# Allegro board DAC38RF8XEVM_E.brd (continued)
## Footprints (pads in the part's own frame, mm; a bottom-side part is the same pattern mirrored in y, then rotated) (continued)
QFN_RLT_7
  rect 1.016x0.305 smd: 1(-1.06,0.75) 2(-1.06,0.25) 3(-1.06,-0.25) 4(-1.06,-0.75)
  rect 1.829x0.356 smd: 5(0.66,-0.6) 6(0.66,0) 7(0.66,0.6)
SMA_SMEL_DUAL_PSF-S01_250X215
  rect 0.508x4.064 smd: 1(0,-2.032)
  rect 3.048x4.064 smd: 2(-3.556,-2.032) 3(3.556,-2.032) 4(-3.556,-2.032) 5(3.556,-2.032)
SMA_THVT_312X312
  round 2.337 hole 1.575: 1(0,0)
  round 2.464 hole 1.702: 2(-2.54,2.54) 3(2.54,2.54) 4(2.54,-2.54) 5(-2.54,-2.54)
SMD_JUMPER_L_0402
  rect 0.508x0.508 smd: 1(-0.508,0) 2(0.508,0) 3(0.508,1.016)
SON_DRB_8
  rect 0.813x0.381 smd: 1(-1.453,0.975) 2(-1.453,0.325) 3(-1.453,-0.325) 4(-1.453,-0.975) 5(1.453,-0.975) 6(1.453,-0.325) 7(1.453,0.325) 8(1.453,0.975)
  rect 1.524x3 smd: 9(0,0)
SON_DSG_8
  rect 0.508x0.33 smd: 1(-0.903,0.75) 2(-0.903,0.25) 3(-0.903,-0.25) 4(-0.903,-0.75) 5(0.903,-0.75) 6(0.903,-0.25) 7(0.903,0.25) 8(0.903,0.75)
  rect 0.762x1.778 smd: 9(0,0)
SON_Q5B_8
  rect 1.372x0.711 smd: 1(-2.767,1.905) 2(-2.767,0.635) 3(-2.767,-0.635) 4(-2.767,-1.905) 5(2.767,-1.905) 6(2.767,-0.635) 7(2.767,0.635) 8(2.767,1.905)
SOT_416_3_63X31
  rect 0.508x0.356 smd: 1(0,-0.152) 2(0,-1.168) 3(1.295,-0.66)
SW_THVT_SPST_PTS635SL43
  round 2.159 hole 1.397: 1(-3.251,0) 2(3.251,0)
TESTPOINT_62DIA
  round 2.337 hole 1.575: 1(0,0)
TFMR_5_150X150_50
  rect 1.651x0.762 smd: 1(1.587,1.27) 2(1.587,0) 3(1.587,-1.27) 4(-1.587,-1.27) 6(-1.587,1.27)
TFMR_6_160X150_50
  rect 1.651x0.762 smd: 1(1.587,1.27) 2(1.587,0) 3(1.587,-1.27) 4(-1.587,-1.27) 5(-1.587,0) 6(-1.587,1.27)
TP_THVT_060_RND
  round 1.575 hole 1.016: 1(0,0)
unnamed#2
  round 2.286 hole 3.175 unplated: (0,0)
VCXO_6_CUSTOM
  rect 5.74x1.956 smd: 1(-3.81,2.54) 2(-3.81,0) 3(-3.81,-2.54) 4(3.81,-2.54) 5(3.81,0) 6(3.81,2.54)
XTAL_4_SM_130X102
  rect 1.4x1.2 smd: 1(-1.1,-0.85) 2(1.1,-0.85) 3(1.1,0.85) 4(-1.1,0.85)

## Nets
1.8V_USB: C74.1 C75.1 C82.2 C84.2 C86.2 C369.2 U4.12(VCORE#12) U4.37(VCORE#37) U4.49(VREGOUT) U4.64(VCORE#64) U29.2(VCCA) U29.10(OE)
1.8VCLK: C379.1 C380.1 C381.1 C382.1 C383.1 C419.1 JP10.1 PP26.1 R218.1 R219.1 U30.9(VCC#9) U30.12(VCC#12) U30.13(VCC#13) U30.14(VCC#14) U30.16(VCC#16)
3.3V_USB: C73.1 C80.2 C81.2 C83.2 C85.2 C87.2 C368.1 FB12.1 FB14.1 FB36.3 R71.2 R72.2 R73.2 U4.20(VCCIO#20) U4.31(VCCIO#31) U4.42(VCCIO#42) U4.50(VREGIN) U4.56(VCCIO#56) U5.6(ORG) U5.8(VCC) U29.19(VCCB)
5.0V_SOURCE: F1.1 J21.1 Q4.5(D5) Q4.6(D6) Q4.7(D7) Q4.8(D8) TP21.1(TP) U9.5(VIN)
5VUSB: R64.1 R67.1
+0.9V_VDDA: C139.1 C140.1 C141.1 C271.1 C272.1 C348.2 FB27.3 PP4.1 U1.F11(VDDA_09V#F11) U1.J11(VDDA_09V#J11)
+0.9V_VDDCLK: C135.1 C136.1 C137.1 C268.1 C269.1 C343.2 FB26.3 PP3.1 R320.1 U1.G9(VDDCLK_09V#G9) U1.H9(VDDCLK_09V#H9)
+0.9V_VDDL1: C110.1 C111.1 C112.1 C250.1 C251.1 C345.2 FB22.3 PP1.1 U1.G8(VDDL1_09V#G8) U1.H8(VDDL1_09V#H8)
+0.9V_VDDL2: C131.1 C132.1 C133.1 C262.1 C263.1 C347.2 FB24.3 PP2.1 U1.G10(VDDL2_09V#G10) U1.H10(VDDL2_09V#H10)
+0.9V_VDDPLL: C143.1 C144.1 C145.1 C274.1 C275.1 C344.2 FB28.3 PP5.1 U1.D8(VDDPLL_09V#D8) U1.E8(VDDPLL_09V#E8)
+0.9V_VDDT: C106.1 C107.1 C108.1 C241.1 C242.1 C342.2 FB20.3 PP9.1 U1.H3(VDDT_09V#H3) U1.J3(VDDT_09V#J3)
+0.9V_VDDTX: C375.1 C376.1 C377.2 C386.1 C387.1 FB37.3 PP24.1 U1.B6(VDDTX)
+1.2V: R255.1
+1.8V_VDDA: C147.1 C148.1 C149.1 C282.1 C283.1 C349.2 FB29.3 PP17.1 U1.G11(VDDA18#G11) U1.H11(VDDA18#H11)
+1.8V_VDDAPLL: C159.1 C160.1 C161.1 C304.1 C305.1 C351.2 FB32.3 PP20.1 U1.B9(VDDAPLL18#B9) U1.B10(VDDAPLL18#B10)
+1.8V_VDDIO: C168.1 C169.1 C244.1 C245.1 C353.2 FB21.3 JP1.1(PIN1) JP2.1(PIN1) PP8.1 R11.1 U1.H5(VDDIO18)
+1.8V_VDDOUTA: C179.1 C291.1 C292.1 C364.2 C400.1 C402.2 FB30.3 L1.2 L2.1 L7.2 L8.1 L9.1 L10.1 PP18.1 R250.1
+1.8V_VDDR: C174.1 C175.1 C220.1 C308.1 C309.1 C356.2 FB33.3 PP23.1 U1.H2(VDDR18#H2) U1.J2(VDDR18#J2)
+1.8V_VDDS: C167.1 C171.1 C218.1 C255.1 C256.1 C358.2 FB23.3 PP7.1 U1.B3(VDDS18#B3) U1.B4(VDDS18#B4)
+1.8V_VDDTX: C170.1 C373.1 C374.2 C417.1 C418.1 FB41.1 PP25.1 U1.B7(VDDTX18)
+1.8V_VDDVCO: C155.1 C156.1 C157.1 C294.1 C295.1 C352.2 FB31.3 PP19.1 U1.D9(VDDAVCO18#D9) U1.E9(VDDAVCO18#E9)
+3.3VCLK: C317.1 C318.1 FB1.2 FB2.1 FB3.1 FB4.1 FB5.1 FB6.1 FB10.1 FB11.1 FB34.3 PP13.1 R20.1 R43.1 R49.1 SJP1.3(PIN3) U21.3(SENSE)
+3.3VIO: C71.1 C72.1 FB36.1 U23.5(VOUT)
+5VIN: C70.1 C222.1 C223.2 C225.1 C300.1 C311.1 C312.2 C313.2 C384.1 C394.1 C415.1 C432.2 D8.1(ANODE) D9.1(ANODE) D10.1(ANODE) FB18.1 R110.1 R140.2 R285.1 U12.10(BIAS) U19.1(VIN) U21.13(EN) U21.15(IN2) U21.16(IN1) U23.1(VIN) U31.3(DEF) U31.10(AVIN) U31.11(PVIN2) U31.12(PVIN1) U31.13(EN) U35.1(EN) U35.7(IN) U37.12(BIAS)
-1.8V_VEE: C163.1 C164.1 C165.1 C176.1 C177.1 C321.1 C322.1 C357.2 FB35.3 PP15.1 R125.1 U1.D10(VEE_-1.8V#D10) U1.E10(VEE_-1.8V#E10) U1.K10(VEE_-1.8V#K10) U1.L10(VEE_-1.8V#L10)
GND: C27.2 C28.2 C31.2 C34.2 C37.1 C38.1 C39.1 C40.1 C41.1 C46.1 C51.1 C52.1 C53.1 C54.1 C55.1 C56.1 C57.1 C58.1 C59.1 C60.1 C61.2 C62.2 C63.1 C64.1 C65.2 C66.2 C67.2 C68.2 C70.2 C71.2 C72.2 C73.2 C74.2 C75.2 C76.2 C77.2 C78.2 C79.2 C80.1 C81.1 C82.1 C83.1 C84.1 C85.1 C86.1 C87.1 C106.2 C107.2 C108.2 C110.2 C111.2 C112.2 C114.2 C115.2 C116.2 C117.2 C118.2 C119.2 C120.1 C122.2 C123.2 C124.2 C125.2 C126.2 C127.2 C128.2 C129.2 C131.2 C132.2 C133.2 C135.2 C136.2 C137.2 C139.2 C140.2 C141.2 C143.2 C144.2 C145.2 C147.2 C148.2 C149.2 C151.2 C152.2 C153.2 C155.2 C156.2 C157.2 C159.2 C160.2 C161.2 C163.2 C164.2 C165.2 C167.2 C168.2 C169.2 C170.2 C171.2 C174.2 C175.2 C176.2 C177.2 C179.2 C218.2 C220.2 C221.2 C222.2 C223.1 C224.1 C225.2 C236.2 C237.2 C241.2 C242.2 C244.2 C245.2 C247.1 C248.2 C249.2 C250.2 C251.2 C253.1 C254.2 C255.2 C256.2 C258.2 C259.2 C260.1 C262.2 C263.2 C268.2 C269.2 C271.2 C272.2 C274.2 C275.2 C282.2 C283.2 C291.2 C292.2 C294.2 C295.2 C300.2 C303.2 C304.2 C305.2 C308.2 C309.2 C311.2 C312.1 C313.1 C314.2 C315.2 C316.2 C317.2 C318.2 C320.2 C321.2 C322.2 C327.2 C328.2 C331.1 C332.1 C342.1 C343.1 C344.1 C345.1 C346.1 C347.1 C348.1 C349.1 C350.1 C351.1 C352.1 C353.1 C356.1 C357.1 C358.1 C364.1 C368.2 C369.1 C373.2 C374.1 C375.2 C376.2 C377.1 C379.2 C380.2 C381.2 C382.2 C383.2 C384.2 C386.2 C387.2 C388.2 C389.1 C390.2 C391.1 C393.2 C394.2 C395.2 C397.2 C398.2 C400.2 C402.1 C403.1 C404.1 C415.2 C417.2 C418.2 C419.2 C420.2 C427.1 C428.2 C429.2 C432.1 C433.1 C434.2 C435.2 C436.2 C440.1 C442.2 C444.2 C445.2 C446.2 C447.1 D1.2(CATHODE) D2.2(CATHODE) D3.2(CATHODE) D4.2(CATHODE) D5.2(CATHODE) D11.2(CATHODE) FB19.2 FB20.2 FB21.2 FB22.2 FB23.2 FB24.2 FB26.2 FB27.2 FB28.2 FB29.2 FB30.2 FB31.2 FB32.2 FB33.2 FB34.2 FB35.2 FB36.2 FB37.2 FB40.2 FB41.2 FB42.2 J1.2(GND#2) J1.3(GND#3) J1.4(GND#4) J1.5(GND#5) J2.2(GND#2) J2.3(GND#3) J2.4(GND#4) J2.5(GND#5) J4.2(GND#2) J4.3(GND#3) J4.4(GND#4) J4.5(GND#5) J6.2(GND#2) J6.3(GND#3) J6.4(GND#4) J6.5(GND#5) J7.2(GND#2) J7.3(GND#3) J7.4(GND#4) J7.5(GND#5) J8.2(GND#2) J8.3(GND#3) J8.4(GND#4) J8.5(GND#5) J11.2 J11.4 J11.6 J11.8 J11.10 J16.5(GND) J16.6(GND1) J16.7(GND2) J16.8(GND3) J16.9(GND4) J20.A1 J20.A4 J20.A5 J20.A8 J20.A9 J20.A12 J20.A13 J20.A16 J20.A17 J20.A20 J20.A21 J20.A24 J20.A25 J20.A28 J20.A29 J20.A32 J20.A33 J20.A36 J20.A37 J20.A40 J20.B2 J20.B3 J20.B6 J20.B7 J20.B10 J20.B11 J20.B14 J20.B15 J20.B18 J20.B19 J20.B22 J20.B23 J20.B26 J20.B27 J20.B30 J20.B31 J20.B34 J20.B35 J20.B38 J20.B39 J20.C1 J20.C4 J20.C5 J20.C8 J20.C9 J20.C12 J20.C13 J20.C16 J20.C17 J20.C20 J20.C21 J20.C24 J20.C25 J20.C28 J20.C29 J20.C32 J20.C33 J20.C36 J20.C38 J20.C40 J20.D2 J20.D3 J20.D6 J20.D7 J20.D10 J20.D13 J20.D16 J20.D19 J20.D22 J20.D25 J20.D28 J20.D37 J20.D39 J20.E1 J20.E4 J20.E5 J20.E8 J20.E11 J20.E14 J20.E17 J20.E20 J20.E23 J20.E26 J20.E29 J20.E32 J20.E35 J20.E38 J20.E40 J20.F3 J20.F6 J20.F9 J20.F12 J20.F15 J20.F18 J20.F21 J20.F24 J20.F27 J20.F30 J20.F33 J20.F36 J20.F39 J20.G1 J20.G4 J20.G5 J20.G8 J20.G11 J20.G14 J20.G17 J20.G20 J20.G23 J20.G26 J20.G29 J20.G32 J20.G35 J20.G38 J20.G40 J20.H3 J20.H6 J20.H9 J20.H12 J20.H15 J20.H18 J20.H21 J20.H24 J20.H27 J20.H30 J20.H33 J20.H36 J20.H39 J20.J1 J20.J4 J20.J5 J20.J8 J20.J11 J20.J14 J20.J17 J20.J20 J20.J23 J20.J26 J20.J29 J20.J32 J20.J35 J20.J38 J20.J40 J20.K2 J20.K3 J20.K6 J20.K9 J20.K12 J20.K15 J20.K18 J20.K21 J20.K24 J20.K27 J20.K30 J20.K33 J20.K36 J20.K39 J21.2 J21.3 J24.2(GND#2) J24.3(GND#3) J24.4(GND#4) J24.5(GND#5) J25.2(GND#2) J25.3(GND#3) J25.4(GND#4) J25.5(GND#5) J26.2(GND#2) J26.3(GND#3) J26.4(GND#4) J26.5(GND#5) J27.2(GND#2) J27.3(GND#3) J27.4(GND#4) J27.5(GND#5) JP1.3(PIN3) JP2.3(PIN3) JP8.1 JP9.1 MT1.1 MT2.1 MT3.1 MT4.1 Q1.2(E) Q2.2(E) Q3.2(E) R2.2 R3.2 R4.2 R5.2 R12.2 R21.2 R24.2 R25.2 R26.2 R27.2 R28.2 R29.2 R33.2 R34.2 R37.2 R38.2 R41.2 R42.2 R45.2 R46.2 R47.2 R48.2 R50.2 R51.2 R53.2 R54.2 R56.2 R58.2 R68.2 R70.1 R106.2 R107.2 R116.2 R126.1 R129.1 R130.1 R131.1 R187.1 R222.2 R224.1 R228.2 R239.2 R240.2 R242.2 R243.2 R256.2 R263.2 R264.2 R265.2 R266.2 R268.2 R269.2 R280.1 R282.2 R283.2 R287.2 R317.1 R318.1 R319.1 R329.2 SJP1.1(PIN1) SW1.1 T1.1(GND1) T1.3(GND2) T1.5(GND3) T3.2(SECONDARY_CT) T3.4(PRIMARY) T8.1(PRIMARY1_GND) T8.2(PRIMARY2_GND) TP1.1(TP) TP2.1(TP) TP14.1(TP) TP22.1(TP) U1.A2(DGND#A2) U1.A8(VSSCLK#A8) U1.A11(VSSCLK#A11) U1.B2(DGND#B2) U1.B8(VSSCLK#B8) U1.B11(VSSCLK#B11) U1.B12(VSSCLK#B12) U1.C2(DGND#C2) U1.C11(AGND#C11) U1.C12(AGND#C12) U1.D2(DGND#D2) U1.D6(DGND#D6) U1.D11(AGND#D11) U1.E2(DGND#E2) U1.E7(DGND#E7) U1.E11(AGND#E11) U1.F2(DGND#F2) U1.F6(DGND#F6) U1.F8(VSSCLK#F8) U1.F9(VSSCLK#F9) U1.F10(VSSCLK#F10) U1.F12(AGND#F12) U1.G2(DGND#G2) U1.G7(DGND#G7) U1.H6(DGND#H6) U1.J7(DGND#J7) U1.J8(VSSCLK#J8) U1.J9(VSSCLK#J9) U1.J10(VSSCLK#J10) U1.J12(AGND#J12) U1.K2(DGND#K2) U1.K11(AGND#K11) U1.L2(DGND#L2) U1.L3(DGND#L3) U1.L4(DGND#L4) U1.L5(DGND#L5) U1.L11(AGND#L11) U1.M6(DGND#M6) U1.M11(AGND#M11) U1.M12(AGND#M12) U2.65(DAP) U4.1(GND#1) U4.5(GND#5) U4.10(AGND) U4.11(GND#11) U4.13(TEST) U4.15(GND#15) U4.25(GND#25) U4.35(GND#35) U4.47(GND#47) U4.51(GND#51) U5.5(GND) U9.2(GND) U12.12(GND) U12.21(PWRPAD) U19.2(GND) U19.9(PAD) U21.7(GND) U21.8(1P6V) U21.21(PWRPAD) U23.2(GND) U29.11(GND) U29.21(PWRPAD) U30.6(GND#6) U30.7(GND#7) U30.8(GND#8) U30.17(PWRPAD) U31.6(AGND) U31.14(PGND#14) U31.15(PGND#15) U31.17(PWRPAD) U34.4(GND) U34.9(PWRPAD) U35.5(GND) U37.8(GND#8) U37.18(GND#18) U37.21(THERMPAD) Y1.3(GND) Y2.2 Y2.4
VDD: C114.1 C115.1 C116.1 C117.1 C118.1 C122.1 C123.1 C124.1 C126.1 C127.1 C128.1 C129.1 C236.1 C237.1 C346.2 FB19.3 PP10.1 R254.1 R286.1 R298.2 R314.2 U1.A5(VDDDIG_09V#A5) U1.B5(VDDDIG_09V#B5) U1.C5(VDDDIG_09V#C5) U1.D5(VDDDIG_09V#D5) U1.D7(VDDDIG_09V#D7) U1.E3(VDDDIG_09V#E3) U1.E4(VDDDIG_09V#E4) U1.E5(VDDDIG_09V#E5) U1.E6(VDDDIG_09V#E6) U1.F4(VDDDIG_09V#F4) U1.F5(VDDDIG_09V#F5) U1.G4(VDDDIG_09V#G4) U1.G5(VDDDIG_09V#G5)
VDDE: C119.1 C120.2 C125.1 C446.1 R314.1 R315.2 U1.F7(VDDDIG_09V#F7) U1.G6(VDDDIG_09V#G6) U1.H7(VDDDIG_09V#H7) U1.J6(VDDDIG_09V#J6)
VDDE_09: C444.1 C445.1 FB42.3 PP27.1 R315.1
VDDOUT18: C151.1 C152.1 C153.1 C350.2 R250.2 U1.G12(VDDOUT18#G12) U1.H12(VDDOUT18#H12)
+1P8V: FB21.1 FB23.1 R307.2 R308.2 R309.2 R310.2 R311.2 R312.2 R332.1 R333.1
ALARM: TP9.1(TP) U1.K8(ALARM)
AMUX0: J22.4 U1.G3(AMUX0)
AMUX1: J22.2 U1.F3(AMUX1)
ATEST: J22.5 U1.C8(ATEST)
CAR_SYSREF_M: R23.1 R24.1 U2.4(SDCLKOUT1N)
CAR_SYSREF_P: R22.1 R25.1 U2.3(SDCLKOUT1P)
CAR_SYSREFM: J20.G10 R23.2
CAR_SYSREFP: J20.G9 R22.2
CLK-IN: R30.1 R32.2 R34.1 T3.6(PRIMARY_DOT)
CLK_LAO_0M: J20.G7 R57.2
CLK_LAO_0P: J20.G6 R55.2
CLKIN1_N: C36.2 C37.2 C371.2 U2.35(CLKIN1N/FBCLKINN/FINN)
CLKIN1_P: C35.2 C372.2 U2.34(CLKIN1P/FBCLKINP/FINP)
CLKINN: C36.1 R35.2 T3.3(SECONDARY)
CLKINP: C35.1 R29.1 R30.2 R35.1 T3.1(SECONDARY_DOT)
CLKLA_0M: R57.1 R58.1 U2.63(DCLKOUT12N)
CLKLA_0P: R55.1 R56.1 U2.62(DCLKOUT12P)
CLKN: C3.1 R36.2
CLKP: C2.1 R31.2
CP1: C30.1 C31.1 R20.2 U2.32(CPOUT1) Y1.1(VC)
CP2: C33.1 C34.1 U2.46(CPOUT2)
DAC_RESET: C27.1 R11.2 R178.1 SW1.2 U1.K9(RESETB)
DAC_SCLK: J23.6 U29.6(A5)
DAC_SDENB: J23.4 U29.9(A8)
DAC_SDIO: J23.2 U29.7(A6)
DAC_SDO: J23.8 U29.8(A7)
DACCLK_IN: J1.1(CENTER) R215.2 R324.1
DACCLK_N: C3.2 C334.2 C449.2 U1.A9(DACCLKN)
DACCLK_P: C2.2 C333.2 C450.2 U1.A10(DACCLKP)
DACCLK_SE: C25.1 C370.2 R1.2 R2.1
DACCLKSE: R1.1 R3.1 U1.A12(DACCLKSE)
DCLKOUT4P: C365.1 U2.24(DCLKOUT4P)
DIV_IN: C378.1 R214.2 R243.1 R282.1
DM: J16.2(D-) R65.1
DP: J16.3(D+) R66.1
DP0_C2M_N_A: C24.1 J20.C3
DP0_C2M_P_A: C23.1 J20.C2
DP1_C2M_N_A: C21.1 J20.A23
DP1_C2M_P_A: C22.1 J20.A22
DP2_C2M_N_A: C18.1 J20.A27
DP2_C2M_P_A: C19.1 J20.A26
DP3_C2M_N_A: C17.1 J20.A31
DP3_C2M_P_A: C16.1 J20.A30
DP4_C2M_N_A: C13.1 J20.A35
DP4_C2M_P_A: C14.1 J20.A34
DP5_C2M_N_A: C10.1 J20.A39
DP5_C2M_P_A: C11.1 J20.A38
DP6_C2M_N_A: C8.1 J20.B37
DP6_C2M_P_A: C9.1 J20.B36
DP7_C2M_N_A: C5.1 J20.B33
DP7_C2M_P_A: C6.1 J20.B32
EEDATA: R74.1 U4.61(EEDATA) U5.3(DI)
EXTIO: C28.1 U1.C10(EXTIO)
FMC_DAC_SCLK: J20.C14 R289.2
FMC_DAC_SDENB: J20.D15 R290.2
FMC_DAC_SDIO: J20.C15 R291.2
FMC_DAC_SDO: J20.D14 R288.2
FMC_LMK_CS: J20.H17 R295.2
FMC_LMK_SCK: J20.G15 R292.2
FMC_LMK_SDIO: J20.G16 R293.2
FMC_LMK_SDO: J20.H16 R294.2
FPGA_CLK1_N: C43.2 J20.K5
FPGA_CLK1_P: C42.2 J20.K4
FPGA_CLK1N: C43.1 R46.1 U2.52(DCLKOUT8N)
FPGA_CLK1P: C42.1 R45.1 U2.51(DCLKOUT8P)
FPGA_CLK2_N: C48.2 J20.J3
FPGA_CLK2_P: C47.2 J20.J2
FPGA_CLK2N: C48.1 R50.1 U2.50(SDCLKOUT9N)
FPGA_CLK2P: C47.1 R51.1 U2.49(SDCLKOUT9P)
FTDI_TCK: U1.K4(TCLK) U29.1(A1)
FTDI_TDI: U1.H4(TDI) U29.3(A2)
FTDI_TDO: U1.J4(TDO) U29.4(A3)
FTDI_TMS: U1.K5(TMS) U29.5(A4)
FTDI_TRSTB: R177.1 U1.J5(TRSTB)
GPIO0: J20.H28 R10.1
GPIO1: J20.H29 R9.1
GTX_CLKM: C32.2 J20.D5
GTX_CLKP: C29.2 J20.D4
GTXCLKM: C32.1 R26.1 U2.2(DCLKOUT0N)
GTXCLKP: C29.1 R27.1 U2.1(DCLKOUT0P)
IFORCE: J22.1 U1.D3(IFORCE)
IOUTA: J6.1(CENTER) R269.1 R273.1
IOUTA_SE: J7.1(CENTER) R264.1 R274.1
IOUTAM: L8.2 R229.1 R241.1 T7.6(SECONDARY) U1.K12(VOUTAM)
IOUTAP: L7.1 R229.2 R239.1 R248.1 T7.4(SECONDARY_DOT) U1.L12(VOUTAP)
IOUTB: J2.1(CENTER) R266.1 R272.1
IOUTBM: L2.2 R199.1 R240.1 R249.2 T5.6(SECONDARY) U1.D12(VOUTBP)
IOUTBP: L1.1 R199.2 R238.2 T5.4(SECONDARY_DOT) U1.E12(VOUTBM)
LMK LOCKED: D3.1(ANODE) R61.1
LMK_CLKIN: J4.1(CENTER) R32.1 R33.1
LMK_CS: R186.1 R295.1 U2.18(\\C\S\)
LMK_DACCLKSE: C25.2 C360.2 R287.1
LMK_SCK: R183.1 R292.1 U2.19(SCK)
LMK_SDIO: R184.1 R293.1 U2.20(SDIO)
LMK_SDO: R185.1 R187.2 R294.1 U2.5(RESET)
NB7_RESET: R232.2 R233.2 R244.1 U30.15(R)
OSCI: C78.1 U4.2(OSCI) Y2.1
OSCINN: C50.2 C51.2 U2.44(OSCINN)
OSCINP: C45.2 C46.2 U2.43(OSCINP)
OSCN: C49.2 C50.1 C366.2 R49.2 R54.1
OSCO: C79.1 U4.3(OSCO) Y2.3
OSCP: C44.2 C45.1 R43.2 R48.1
PLL2 LOCKED: D4.1(ANODE) R62.1
RX0N: C24.2 U1.M4(RXN3)
RX0P: C23.2 U1.M5(RXP3)
RX1N: C21.2 U1.M3(RXN2)
RX1P: C22.2 U1.M2(RXP2)
RX2N: C18.2 U1.L1(RXN1)
RX2P: C19.2 U1.M1(RXP1)
RX3N: C17.2 U1.K1(RXN0)
RX3P: C16.2 U1.J1(RXP0)
RX4N: C13.2 U1.F1(RXN5)
RX4P: C14.2 U1.E1(RXP5)
RX5N: C10.2 U1.B1(RXN7)
RX5P: C11.2 U1.A1(RXP7)
RX6N: C8.2 U1.C1(RXN6)
RX6P: C9.2 U1.D1(RXP6)
RX7N: C5.2 U1.G1(RXN4)
RX7P: C6.2 U1.H1(RXP4)
SCLK: J23.5 R289.1 U1.L9(SCLK)
SDENB: J23.3 R290.1 U1.M8(SDENB)
SDIO: J23.1 R291.1 U1.M10(SDIO)
SDO: J23.7 R288.1 U1.M9(SDO)
SLEEP: JP1.2(PIN2) U1.L8(SLEEP)
SPARE1: J11.3 R10.2 U1.L7(GPO0)
SPARE2: J11.7 U1.L6(GPO1)
SPARE3: J11.1 R9.2 U1.K7(GPI0)
SPARE4: J11.5 U1.M7(GPI1)
STAT 0: D1.1(ANODE) R59.1
STAT 1: D2.1(ANODE) R60.1
SYNC: R148.2 U2.6(SYNC)
SYNC0BN: J20.F11 U1.C3(SYNC0BN)
SYNC0BP: J20.F10 U1.C4(SYNC0BP)
SYNC1BN: J20.F20 U1.C6(SYNC1BN)
SYNC1BP: J20.F19 U1.C7(SYNC1BP)
SYSREF+: R40.1 R41.1 U2.14(SDCLKOUT3N)
SYSREF-: R39.1 R42.1 U2.13(SDCLKOUT3P)
SYSREF-N: R5.1 R104.2 U1.A4(SYSREFN)
SYSREF-P: R4.1 R103.2 U1.A3(SYSREFP)
SYSREFN: R39.2 R104.1 R107.1
SYSREFP: R40.2 R103.1 R106.1
TESTMODE: TP10.1(TP) U1.K3(TESTMODE)
TXENABLE: JP2.2(PIN2) U1.K6(TXENABLE)
U37_BYPASS: R121.1 R122.2
USB_DM: C77.1 R65.2 U4.7(DM)
USB_DP: C76.1 R66.2 U4.8(DP)
USB_EECLK: R72.1 U4.62(EECLK) U5.2(CLK)
USB_EECS: R71.1 U4.63(EECS) U5.1(CS)
USB_REF: R68.1 U4.6(REF)
USB_RST: R69.2 U4.14(RESET)
VAR: C258.1 C259.1 C260.2 C395.1 FB40.1 L5.2 R227.1 R330.1 R331.2 R332.2 U12.5(IN1) U12.6(IN2) U12.7(IN3) U12.8(IN4) U12.11(EN) U35.4(VOS)
VDIG: C428.1 C429.1 L3.2 R121.2 R221.1 R226.2 R296.1 U31.16(VOS)
VSENSE: J22.3 U1.D4(VSENSE)
Y2_N: R52.1 R53.1 Y1.4(OUT_N)
Y2_P: R44.1 R47.1 Y1.5(OUT_P)
YO2_N: C49.1 R52.2
YO2_P: C44.1 R44.2
N16791764: J16.1(VBUS) R64.2
N16791900: C67.1 C68.1 FB14.2 FB17.2 U4.4(VPHY)
N16791904: C65.1 C66.1 FB12.2 U4.9(VPLL)
N16792068: R67.2 R69.1 R70.2
N16792392: R73.1 R74.2 U5.4(DO)
N16935208: R178.2 U4.22(ADBUS5)
N16935212: R177.2 U4.21(ADBUS4)
N16935236: R174.2 U4.17(ADBUS1)
N16935238: R176.2 U4.19(ADBUS3)
N16935240: R173.2 U4.16(ADBUS0)
N16935242: R175.2 U4.18(ADBUS2)
N17033323: FB17.1 R63.1
N17033325: D5.1(ANODE) R63.2
N17488920: Q2.1(B) R82.2
N17488936: J20.C18 R80.1
N17488940: Q3.1(B) R83.2
N17488944: J20.D18 R83.1
N17488958: J20.D17 R82.1
N17488997: Q2.3(C) R81.2
N17489014: Q1.1(B) R80.2
N17489769: D9.2(CATHODE) R81.1
N17489787: D8.2(CATHODE) R79.1
N17489827: D10.2(CATHODE) R84.1
N17512943: R12.1 U1.C9(RBIAS)
N17771557: R297.1 R299.2 R300.2 R301.2 R302.2 R303.2 R304.2 R305.1 R316.2 R321.1
N17785139: R125.2 R126.2 U19.5(VFB)
N17785180: C303.1 R306.2 U19.4(VOUT)
N17787232: C314.1 C315.1 C316.1 FB34.1 U21.1(OUT1) U21.20(OUT2)
N17787234: C320.1 U21.14(NR)
N17787274: R129.2 U21.12(0P1V)
N17787303: R130.2 U21.11(0P2V)
N17787374: R131.2 U21.10(0P4V)
N17829143: R140.1 U23.3(EN)
N17906763: J8.1(CENTER) R148.1
N17929635: C333.1 T1.6(SEC DOT)
N17930246: C1.2 T1.2(PRI DOT)
N17930866: C334.1 T1.4(SEC)
N17940319: C330.1 C332.2 L9.2 T5.5(SECONDARY_CT)
N17940351: C327.1 C330.2 C331.2 T5.2(PRIMARY)
N17971041: C328.1 C329.1 R238.1 T5.3(PRIMARY_DOT)
N18050278: C360.1 U2.40(OSCOUTP)
N18051729: R179.2 U4.38(CDBUS0)
N18051775: R180.2 U4.39(CDBUS1)
N18051825: R181.2 U4.40(CDBUS2)
N18051839: R182.2 U4.41(CDBUS3)
N18096853: R173.1 U29.20(B1)
N18096873: R174.1 U29.18(B2)
N18096893: R175.1 U29.17(B3)
N18096913: R176.1 U29.16(B4)
N18119227: C365.2 J24.1(CENTER)
N18119976: C366.1 J25.1(CENTER)
N18127566: R179.1 U29.15(B5)
N18127584: R180.1 U29.14(B6)
N18127610: R181.1 U29.13(B7)
N18127628: R182.1 U29.12(B8)
N18263954: C1.1 C370.1 R213.1 R242.1
N18264001: R210.2 R211.1 R212.1
N18264055: R212.2 R214.1
N18273767: R210.1 R213.2
N18273790: R211.2 R215.1
N18276385: C372.1 R218.2 U30.11(Q)
N18276388: C371.1 R219.2 U30.10(Q\)
N18284547: C378.2 U30.2(CLK)
N18303715: FB37.1 R305.2
N18304202: C388.1 C389.2 C390.1 R331.1 U34.5(EN) U34.7(IN2) U34.8(IN1)
N18304279: C392.1 R224.2 R225.1 U34.3(FB/SNS)
N18304291: C391.2 U34.6(NR)
N18304307: C392.2 C393.1 R225.2 R333.2 U34.1(OUT1) U34.2(OUT2)
N18314120: C247.2 C248.1 C249.1 C253.2 C254.1 R252.1 R297.2 U12.1(OUT1) U12.18(OUT4) U12.19(OUT3) U12.20(OUT2)
N18315082: R227.2 R228.1 R330.2 U35.3(FB)
N18315084: L5.1 U35.6(SW)
N18332054: C397.1 C401.2 C403.2 T7.2(PRIMARY)
N18332084: C398.1 C399.1 R248.2 T7.3(PRIMARY_DOT)
N18332340: C401.1 C404.2 L10.2 T7.5(SECONDARY_CT)
N18332593: U30.1(VTCLK) U30.4(V\T\C\L\K\) U30.5(VREFAC)
N18332678: J20.H19 R232.1
N18332757: R233.1 U4.23(ADBUS6)
N18336017: C438.1 R267.2 U1.A7(CLKTXP)
N18336019: C439.1 R267.1 U1.A6(CLKTXN)
N18340991: C407.2 J26.1(CENTER) R280.2
N18368981: C413.1 R241.2 T7.1(NOTUSED)
N18431978: C420.1 FB40.3 JP10.2
N18450019: J11.9 R244.2
N18458788: R249.1 T5.1(NOTUSED)
N18476239: JP3.1 Y1.6(VDD)
N18477216: R115.1 R116.1 U12.16(FB/SNS)
N18478341: R252.2 U12.9(PG)
N18509121: C385.2 U31.7(CP)
N18509124: C385.1 U31.8(CN)
N18509909: C427.2 U31.9(SS)
N18510430: R221.2 R222.1 R298.1 U31.5(FB)
N18510599: L3.1 U31.1(SW1) U31.2(SW2)
N18511967: R226.1 U31.4(PG)
N18517211: FB19.1 R122.1 R284.1
N18526029: C435.1 C436.1 R258.1 R296.2 U37.15(IN1) U37.16(IN2) U37.17(IN3)
N18526063: JP8.2 R258.2 U37.14(EN)
N18526106: C433.2 C434.1 C441.2 R284.2 U37.1(OUT1) U37.19(OUT2) U37.20(OUT3)
N18526174: C441.1 R254.2 R256.1 U37.3(FB)
N18526182: R255.2 U37.4(PG)
N18554997: D11.1(ANODE) R110.2
N18555017: C221.1 C224.2 F1.2 FB18.2 Q4.1(S1) Q4.2(S2) Q4.3(S3)
N18555159: Q4.4(G) U9.4(GATE)
N18592420: C413.2 R263.1 R274.2
N18592542: C399.2 R268.1 R273.2
N18601933: C329.2 R265.1 R272.2
N18620813: C407.1 T8.3(PRIMARY_DOT)
N18681043: C438.2 T8.4(SECONDARY)
N18681093: C439.2 T8.6(SECONDARY_DOT)
N18682404: C443.1 U2.41(OSCOUTN)
N18687770: C440.2 U37.13(NR/SS)
N18691780: C307.1 U19.7(C1-)
N18691785: C307.2 U19.8(C1+)
N18692860: C442.1 U19.3(CPOUT)
N18693421: JP9.2 R285.2 U19.6(EN)
N18712409: R286.2 U37.2(SNS)
N18715563: C443.2 R283.1
N18716152: R183.2 U4.43(CDBUS4)
N18716161: R184.2 U4.44(CDBUS5)
N18716170: R185.2 U4.45(CDBUS6)
N18716191: R186.2 U4.46(CDBUS7)
N18721299: FB22.1 R300.1
N18721339: FB24.1 R301.1
N18721381: FB26.1 R302.1
N18721425: FB27.1 R303.1
N18721471: FB28.1 R304.1
N18728685: FB35.1 R306.1
N18728712: FB31.1 R307.1
N18728940: FB32.1 R308.1
N18728990: FB41.3 R309.1
N18729042: FB33.1 R310.1
N18729096: FB29.1 R311.1
N18729152: FB30.1 R312.1
N18737961: FB42.1 R316.1
N18760111: R317.2 U37.7(200MV)
N18760140: R318.2 U37.6(100MV)
N18760186: R319.2 U37.5(50MV)
N18774590: FB20.1 R299.1
N18804219: C447.2 U12.15(SS)
N18805050: R115.2 R320.2 R321.2
N18858975: C450.1 R323.1
N18859137: J27.1(CENTER) R323.2
N18870035: C448.1 U2.25(DCLKOUT4N)
N18870037: C448.2 R329.1
N18893766: C449.1 R324.2
N19080738: C38.2 C39.2 C40.2 C41.2 FB1.1 JP3.2
N19081029: SJP1.2(PIN2) Y1.2(NC)
N19083254: R61.2 U2.31(STATUS_LD1)
N19083268: R62.2 U2.48(STATUS_LD2)
N19083286: R60.2 U2.59(CLKIN_SEL1)
N19083328: R59.2 U2.58(CLKIN_SEL0)
N19083344: C61.1 U2.12(LDOBYP2)
N19083346: C62.1 U2.11(LDOBYP1)
N19083364: C52.2 C53.2 C54.2 FB2.2 U2.10(VCC1_VCO) U2.33(VCC5_DIG) U2.36(VCC6_PLL1)
N19083444: FB7.2 U2.39(VCC7_OSCOUT)
N19083446: FB9.2 U2.45(VCC9_CP2)
N19083508: C58.2 C59.2 C60.2 FB6.2 FB7.1 FB8.1 FB9.1 U2.47(VCC10_PLL2)
N19083566: C56.2 FB3.2 U2.21(VCC3_SYSREF)
N19083568: C55.2 FB5.2 U2.17(VCC2_CG1)
N19083616: C64.2 FB11.2 U2.64(VCC12_CG0)
N19083618: C63.2 FB10.2 U2.53(VCC11_CG3)
N19083707: C57.2 FB4.2 U2.26(VCC4_CG2)
N19086842: R36.1 R38.1 U2.16(DCLKOUT2N)
N19086844: R31.1 R37.1 U2.15(DCLKOUT2P)
N19234861: FB8.2 U2.42(VCC8_OSCIN)
N174889162: Q3.3(C) R84.2
N174890102: Q1.3(C) R79.2
N176074941: C33.2 R28.1
N176076570: C30.2 R21.1

Pads without a net: J16 4; J20 A2 A3 A6 A7 A10 A11 A14 A15 A18 A19 B1 B4 B5 B8 B9 B12 B13 B16 B17 B20 B21 B24 B25 B28 B29 B40 C6 C7 C10 C11 C19 C22 C23 C26 C27 C30 C31 C34 C35 C37 C39 D1 D8 D9 D11 D12 D20 D21 D23 D24 D26 D27 D29 D30 D31 D32 D33 D34 D35 D36 D38 D40 E2 E3 E6 E7 E9 E10 E12 E13 E15 E16 E18 E19 E21 E22 E24 E25 E27 E28 E30 E31 E33 E34 E36 E37 E39 F1 F2 F4 F5 F7 F8 F13 F14 F16 F17 F22 F23 F25 F26 F28 F29 F31 F32 F34 F35 F37 F38 F40 G2 G3 G12 G13 G18 G19 G21 G22 G24 G25 G27 G28 G30 G31 G33 G34 G36 G37 G39 H1 H2 H4 H5 H7 H8 H10 H11 H13 H14 H20 H22 H23 H25 H26 H31 H32 H34 H35 H37 H38 H40 J6 J7 J9 J10 J12 J13 J15 J16 J18 J19 J21 J22 J24 J25 J27 J28 J30 J31 J33 J34 J36 J37 J39 K1 K7 K8 K10 K11 K13 K14 K16 K17 K19 K20 K22 K23 K25 K26 K28 K29 K31 K32 K34 K35 K37 K38 K40; J22 6; T8 5; U2 7 8 9 22 23 27 28 29 30 37 38 54 55 56 57 60 61; U4 24 26 27 28 29 30 32 33 34 36 48 52 53 54 55 57 58 59 60; U5 7; U9 1 3; U12 2 3 4 13 14 17; U21 2 4 5 6 9 17 18 19; U23 4; U30 3; U35 2; U37 9 10 11

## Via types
v1: diameter 0.457, hole 0.203, TOP to BOTTOM, 2734 vias
v2: diameter 0.305, hole 0.152, TOP to BOTTOM, 109 vias
v3: diameter 0.559, hole 0.305, TOP to BOTTOM, 528 vias
v4: diameter 0.508, hole 0.254, TOP to BOTTOM, 108 vias
v5: diameter 0.406, hole 0.203, TOP to BOTTOM, 8 vias

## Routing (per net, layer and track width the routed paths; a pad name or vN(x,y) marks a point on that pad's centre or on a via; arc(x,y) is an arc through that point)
1.8V_USB: length 8.4
  TOP w0.305: v1(35.03,56.59) 34.95,56.64 34.38,56.64 34.32,56.59 C86.2 33.2,56.59 v1(31.9,56.59)
  BOTTOM w0.305: U4.64 v1(35.06,50.48) ; U4.37 v1(43.1,56.59) ; U4.49 42.6,49.17 v1(43.41,49.17) ; U4.12 v1(31.9,56.59)
  BOTTOM w0.381: v1(52.1,55.14) 51.8,55.43 U29.10
  vias: v1(34.44,49.66) v1(42.11,56.62) v1(43.48,50.04) v1(44.25,49.53) v1(44.25,48.49) v1(44.27,50.5) v1(52.73,59.49)
1.8VCLK: length 13
  TOP w0.305: v1(81.86,43) 82.17,43.31 v1(83.31,43.31) ; v1(83.31,41.05) 82.19,41.05 C380.1
  L6_PWR_SIG w0.432: JP10.1 86.53,58.23 ; JP10.1 85.65,57.94 ; JP10.1 84.77,58.23 ; JP10.1 86.82,59.11 ; JP10.1 84.77,59.98 ; JP10.1 84.48,59.11 ; JP10.1 86.53,59.98
  BOTTOM w0.305: v1(81.2,39.62) 80.67,40.16 U30.14
  vias: v1(79.6,40.84) v1(79.6,40.03) v1(81.23,40.44) v1(81.81,41.4) v1(87.54,58.7)
3.3V_USB: length 10.4
  TOP w0.305: v1(48.13,60.83) 49.5,60.83 v1(49.56,60.88) ; v1(38.23,47.52) v1(37.62,47.52) R72.2
  BOTTOM w0.305: U4.31 v1(42.06,59.21) ; U4.50 v1(42.06,50.55) ; v1(36.6,59) 36.56,59.04 U4.20 ; U4.42 v1(43.09,54.09) ; v1(38.89,50.93) 39.06,50.75 U4.56
  vias: v1(25.02,56.39) v1(25.43,55.83) v1(25.83,55.3) v1(35.56,55.5) v1(35.59,59) v1(35.63,57.39) v1(36.7,55.5) v1(36.93,57.39) v1(40.01,51.36) v1(40.59,52.22) v1(41.15,51.36) v1(42.11,58.14) v1(42.37,54.46) v1(42.37,51.41) v1(48.13,61.67) v1(49.1,60.2) v1(49.17,61.62) v1(49.56,59.48)
5.0V_SOURCE: length 155.2
  TOP w0.432: 20.41,65.47 TP21.1 ; TP21.1 22.77,67.83 ; TP21.1 21.59,65.05 ; TP21.1 21.59,68.25 ; TP21.1 22.77,65.47 ; TP21.1 19.99,66.65 ; TP21.1 20.41,67.83 ; TP21.1 23.19,66.65 ; 17.04,61.26 J21.1 ; J21.1 18.93,61.97 ; J21.1 17.04,66.45 ; J21.1 15.16,61.97 ; J21.1 19.63,63.86 ; J21.1 15.16,65.74 ; J21.1 14.45,63.86 ; J21.1 18.93,65.74
  L3_PWR w0.432: TP21.1 22.77,65.47 ; TP21.1 20.41,65.47 ; TP21.1 22.77,67.83 ; TP21.1 19.99,66.65 ; TP21.1 23.19,66.65 ; TP21.1 21.59,65.05 ; TP21.1 20.41,67.83 ; J21.1 18.93,65.74 ; J21.1 18.93,61.97 ; J21.1 19.63,63.86 ; J21.1 14.45,63.86 ; J21.1 17.04,61.26 ; J21.1 17.04,66.45 ; J21.1 15.16,65.74
  L6_PWR_SIG w0.432: J21.1 19.63,63.86 ; J21.1 18.93,65.74 ; J21.1 15.16,65.74 ; J21.1 17.04,66.45 ; J21.1 18.93,61.97 ; J21.1 17.04,61.26 ; J21.1 15.16,61.97 ; J21.1 14.45,63.86 ; TP21.1 23.19,66.65 ; TP21.1 20.41,67.83 ; TP21.1 20.41,65.47 ; TP21.1 22.77,67.83 ; TP21.1 22.77,65.47 ; TP21.1 19.99,66.65 ; TP21.1 21.59,65.05
  BOTTOM w0.127: v3(28.91,63.81) v3(28.91,64.81) ; v3(28.91,63.81) v3(29.91,63.81) v3(29.91,64.81) ; v3(28.91,63.81) v3(27.91,63.81) ; v3(28.91,64.81) v3(29.91,64.81) ; v3(28.91,64.81) 27.94,64.81 v3(27.92,64.79) ; v3(28.91,64.81) v3(28.91,65.81) ; v3(26.91,65.81) v3(26.91,64.81) ; v3(26.91,65.81) v3(27.91,65.81) ; v3(26.91,65.81) v3(25.91,65.81) ; v3(26.91,64.81) v3(25.91,64.81) ; v3(26.91,64.81) 26.93,64.79 v3(27.92,64.79) ; v3(26.91,64.81) v3(26.91,63.81) ; v3(27.91,63.81) 27.91,64.78 v3(27.92,64.79) ; v3(27.91,63.81) v3(26.91,63.81) ; v3(25.91,65.81) 26.01,65.91 Q4.5 ; v3(25.91,65.81) v3(25.91,64.81) ; v3(27.91,65.81) 27.92,65.8 v3(27.92,64.79) ; v3(27.91,65.81) v3(28.91,65.81) ; v3(29.91,64.81) v3(29.91,65.81) ; Q4.8 29.82,65.91 v3(29.91,65.81) ; v3(25.91,64.81) v3(25.91,63.81) v3(26.91,63.81) ; v3(29.91,65.81) v3(28.91,65.81)
  BOTTOM w0.432: 15.16,61.97 J21.1 ; J21.1 18.93,65.74 ; J21.1 19.63,63.86 ; J21.1 14.45,63.86 ; J21.1 15.16,65.74 ; J21.1 17.04,66.45 ; J21.1 18.93,61.97 ; J21.1 17.04,61.26 ; TP21.1 21.59,68.25 ; TP21.1 19.99,66.65 ; TP21.1 23.19,66.65 ; TP21.1 20.41,67.83 ; TP21.1 21.59,65.05 ; TP21.1 22.77,65.47 ; TP21.1 20.41,65.47 ; TP21.1 22.77,67.83
5VUSB: length 18.4
  L3_PWR w0.508: v1(12.29,52.35) 12.83,52.88 13.54,52.88 14.71,54.05 14.71,55.58 16.76,57.63 26.62,57.63 v1(27.3,58.32)
+0.9V_VDDA: length 10.3
  TOP w0.508: C139.1 v1(25.64,21.49)
  L6_PWR_SIG w0.102: 29.59,24.51 29.51,24.59 29.03,24.59 28.81,24.37 28.81,23.86 28.8,23.85 ; 29.71,24.75 29.61,24.85 29.61,25.17 29.72,25.28 29.72,25.4 29.59,25.53 29.59,26.03 ; 29.59,26.95 29.96,26.99 30.15,26.99 30.32,26.82 ; 29.03,28.6 29.04,28.59 29.35,28.59 29.57,28.37 29.57,28.05 29.44,27.91 ; 29.41,27.74 29.41,27.73 29.57,27.57 29.57,27.23 29.51,27.18 ; 28.8,26.57 28.81,26.56 28.81,26.45 29.03,26.23 29.31,26.23 ; 30.35,23.7 30.35,23.59 30.37,23.57 30.37,23.25 30.15,23.03 29.75,23.03
  L6_PWR_SIG w0.127: 28.55,21.21 28.64,21.3 28.81,21.3 29.07,21.56 29.07,21.96 28.93,22.1 ; 25.76,23.88 26.08,24.2 26.51,24.2 26.83,23.88 26.9,23.88
  vias: v1(28.39,29.01) v1(28.39,26.61) v1(97.33,29.06) v1(97.31,28.09) v1(97.28,27.23) v1(98.25,28.09) v1(98.25,27.2) v1(98.27,29.06) v1(99.24,29.06) v1(99.21,28.07) v1(99.21,27.18)
+0.9V_VDDCLK: length 72.6
  TOP w0.381: 29.84,27.86 v1(29.99,27.41) 30.15,27.79 v1(29.99,28.21) 29.84,27.86
  L4_SIG w0.381: v1(29.99,28.21) v1(29.99,27.41)
  L6_PWR_SIG w0.102: 30.63,27.83 30.95,27.83 31.17,28.05 31.17,28.37 30.96,28.58 ; 29.69,30.18 29.69,30.06 29.61,29.97 29.61,29.66 29.81,29.45 ; 30.95,29.43 31.17,29.66 31.17,29.97 31.09,30.05 31.09,30.15 ; 30.99,31.04 30.99,30.95 31.17,30.77 31.17,30.45 30.98,30.26 ; 29.69,29.36 29.69,29.26 29.61,29.17 29.61,28.86 29.76,28.7 ; 29.72,30.96 29.72,30.88 29.61,30.77 29.61,30.45 29.8,30.26
  L6_PWR_SIG w0.127: 31.93,32 31.94,32 31.99,31.96 32.35,31.96 32.61,32.22 32.61,32.69 32.49,32.82
  L6_PWR_SIG w0.152: v1(76.63,50.32) 75.67,50.32 72.8,47.45 63.37,47.45 61.93,48.9 57.38,48.9 56.82,49.45 53.82,49.45 53.57,49.2 51.93,49.2 51.48,48.75 51.1,48.75 50.53,49.33 48.95,49.33 46.71,47.09 46.71,45.24 46.05,44.58 42.55,44.58 41.43,43.46 41.43,41.41 38.82,38.81 33.2,38.81 29.13,34.75 29.13,32 29.36,31.78 29.95,31.78 29.97,31.75
  BOTTOM w0.381: v1(29.99,27.41) 30,27.79 v1(29.99,28.21)
  BOTTOM w0.483: C343.2 31.41,35.97 v1(31.38,35.94)
  vias: v1(31.46,32.41) v1(43.21,42.06) v1(43.21,41.05) v1(44.35,41.02) v1(44.37,42.09) v1(45.54,42.09) v1(45.54,41.07) v1(46.66,41.02) v1(46.69,42.09)
+0.9V_VDDL1: length 7.5
  TOP w0.381: v1(30.79,28.21) 31.01,27.79 v1(30.79,27.41) v1(30.79,28.21)
  L3_PWR w0.102: 30.99,29.35 31.17,29.54 31.17,29.97 30.99,30.15 ; 30.99,29.35 31.17,29.17 31.17,28.85 30.95,28.63 ; 30.99,29.35 30.99,29.39 ; 30.99,30.15 31.17,30.34 31.17,30.77 30.96,30.98 30.96,31.06 ; 30.99,30.15 30.99,30.2
  L4_SIG w0.381: v1(30.79,28.21) v1(30.79,27.41)
  BOTTOM w0.381: v1(30.79,28.21) 30.66,27.81 v1(30.79,27.41) 30.91,27.81 v1(30.79,28.21)
  BOTTOM w0.483: v1(31.38,34.33) 31.4,34.35 C345.2
  vias: v1(32.1,33.37) v1(47.88,42.21) v1(47.9,41.12) v1(48.97,41.12) v1(49,42.19) v1(50.06,42.16) v1(50.06,41.12) v1(51.18,42.19) v1(51.21,41.15)
+0.9V_VDDL2: length 7.2
  TOP w0.305: v1(29.19,27.41) 29.41,27.74 v1(29.19,28.21)
  TOP w0.381: v1(29.19,28.21) v1(29.19,27.41)
  L3_PWR w0.102: 28.09,29.51 28.09,29.26 28.01,29.17 28.01,28.86 28.23,28.63 28.75,28.63 28.87,28.51 ; 29.39,28.67 29.57,28.86 29.57,29.17 29.35,29.39 29.31,29.39 29.26,29.44
  L4_SIG w0.381: v1(29.19,28.21) v1(29.19,27.41)
  BOTTOM w0.381: 29.36,27.81 v1(29.19,27.41) 29.06,27.81 v1(29.19,28.21) 29.36,27.81
  BOTTOM w0.508: C347.2 27.17,33.78 v1(27.43,33.78)
  vias: v1(37.39,42.04) v1(37.39,41.17) v1(38.35,42.04) v1(38.35,41.17) v1(39.42,41.17) v1(39.47,42.01) v1(40.54,42.01) v1(40.54,41.17)
+0.9V_VDDPLL: length 11.7
  TOP w0.381: v1(30.79,25.81) 30.89,25.37 v1(30.79,25.01) 30.64,25.4 v1(30.79,25.81)
  TOP w0.483: v1(56.18,32.26) 56.18,32.26 C143.1
  L4_SIG w0.381: v1(30.79,25.01) v1(30.79,25.81)
  L6_PWR_SIG w0.102: 31.21,24.16 31.21,24.05 31.43,23.83 31.75,23.83 31.95,24.03 32.03,24.03 32.23,23.83 32.55,23.83 32.77,24.05 32.81,24.05 33.03,23.83 33.38,23.83 33.55,24 33.55,24.03 33.63,24.03 33.83,23.83 34.15,23.83 34.34,24.03 34.44,24.03 34.63,23.83 34.98,23.83 35.18,24.03 35.23,24.03 35.43,23.83 35.8,23.83 36.04,24.08 ; 36.55,26.85 36.55,27.18 36.78,27.41 36.79,27.41
  L6_PWR_SIG w0.127: 37.16,27.41 36.79,27.41
  BOTTOM w0.381: 30.96,25.35 v2(30.89,25.4) 30.96,25.37 v1(30.79,25.81) 30.64,25.4 v1(30.79,25.01) 30.96,25.35
  vias: v1(55.97,30.95) v1(57.43,32.21) v1(57.43,31.22) v1(57.4,30.15) v1(58.55,30.15) v1(58.57,32.21) v1(58.57,31.22) v1(59.72,32.21) v1(59.69,31.22) v1(59.69,30.15)
+0.9V_VDDT: length 7.8
  TOP w0.381: v1(34.79,28.21) 34.52,28.63 v1(34.79,29.01) 34.92,28.56 v1(34.79,28.21)
  L3_PWR w0.102: 35,29.41 35.17,29.58 35.17,29.97 35.08,30.06 35.08,30.07 ; 35.26,30.33 35.34,30.33 35.43,30.23 35.75,30.23 35.97,30.45 35.97,30.78 ; 36.5,31.5 36.79,31.5
  L3_PWR w0.127: 37.34,31.75 37.08,31.5 36.79,31.5
  L4_SIG w0.381: v1(34.79,29.01) v1(34.79,28.21)
  BOTTOM w0.381: v1(34.79,29.01) 34.52,28.63 v1(34.79,28.21) 34.92,28.56 v1(34.79,29.01) ; v1(34.79,29.01) 34.93,29.15 C108.1
  BOTTOM w0.483: C342.2 v1(53.16,33.38)
  vias: v1(65.74,41.55) v1(65.74,40.72) v1(66.73,41.55) v1(66.75,40.72) v1(67.79,41.58) v1(67.79,40.72) v1(68.94,41.53) v1(68.94,40.64) v2(41.45,34.28)
+0.9V_VDDTX: length 3.1
  L6_PWR_SIG w0.102: 33.57,22.71 33.57,22.77 33.35,22.99 33.33,22.99 ; 33.57,22.71 33.63,22.71 33.63,22.21 ; 33.57,22.71 33.57,22.31 ; 33.33,22.99 33.33,23.01 32.79,23.01 32.81,22.99 33.33,22.99 ; 33.51,22.21 33.42,22.31 33.57,22.31 ; 33.55,22.28 33.57,22.29 33.57,22.31
  L6_PWR_SIG w0.127: 33.51,22.21 33.63,22.1 33.63,22.21
  vias: v1(32.39,23.41) v1(38.3,20.36) v1(75.08,27.43) v1(76.25,28.91) v1(76.28,28.07) v1(76.3,27.13) v1(77.22,28.91) v1(77.24,28.07) v1(77.27,27.13) v1(78.23,28.91) v1(78.26,28.04) v1(78.21,27.13)
+1.2V:
  vias: v1(59.51,50.14)
+1.8V_VDDA: length 7
  TOP w0.381: v1(28.39,27.41) 28.57,27.86 28.45,28.09 v1(28.39,28.21) 28.19,27.81 v1(28.39,27.41)
  L3_PWR w0.102: 27.28,28.55 27.36,28.63 27.81,28.63 27.99,28.45 27.99,28.24
  L3_PWR w0.127: 27.18,28.55 27.28,28.55 27.28,28.55
  L4_SIG w0.381: v1(28.39,28.21) v1(28.39,27.41)
  BOTTOM w0.127: C349.2 19.17,25.99 v1(19.15,26.01)
  BOTTOM w0.381: v1(28.39,27.41) 28.24,27.27 C148.1 28.19,27.81 ; v1(28.39,27.41) v1(28.39,28.21) ; v1(28.39,27.41) 28.19,27.81 ; v1(28.39,28.21) 28.25,28.35 C149.1 28.19,27.81 ; v1(28.39,28.21) 28.19,27.81
  vias: v1(92.91,28.96) v1(92.94,28.09) v1(92.96,27.18) v1(93.88,28.96) v1(93.9,28.07) v1(93.93,27.15) v1(94.84,28.93) v1(94.84,28.07) v1(94.84,27.15)
+1.8V_VDDAPLL: length 11.8
  TOP w0.381: 29.57,23.09 v1(29.99,23.41) 29.57,23.54 v1(29.19,23.41) 29.57,23.09
  L3_PWR w0.127: 45.47,14 45.52,14 45.66,13.86 46.06,13.86 46.3,14.1 ; 44.09,14.15 44.09,14.12 43.76,13.78 41.93,13.78 41.79,13.92 41.55,13.92 ; 44.4,13.97 44.43,13.97 44.55,13.86 44.95,13.86 45.19,14.1
  L4_SIG w0.381: 29.57,23.09 29.57,23.41 ; 29.57,23.09 29.66,23.09 v1(29.99,23.41) 29.57,23.41 ; 29.57,23.09 29.51,23.09 v1(29.19,23.41) 29.57,23.41
  BOTTOM w0.305: v1(29.19,23.41) 29.57,23.09 v1(29.99,23.41)
  BOTTOM w0.381: v1(29.99,23.41) v1(29.19,23.41) 29.57,23.54 v1(29.99,23.41) ; v1(29.99,23.41) 30.16,23.41 C161.1
  vias: v1(31.62,14.88) v1(33.14,14.65) v1(84.63,29.03) v1(84.63,28.07) v1(84.68,27) v1(85.65,29.06) v1(85.65,28.07) v1(85.67,27.03) v1(86.69,29.06) v1(86.69,28.07) v1(86.69,27.03)
+1.8V_VDDIO: length 96.9
  L4_SIG w0.305: JP1.1 101.6,42.9 101.6,45.39 98.5,48.49 93.21,48.49 JP2.1 91.22,50.42 84.63,43.83 84.63,41.2 81.51,38.07 74.12,38.07 73.56,38.63 57.56,38.63 v1(54.86,41.33)
  L6_PWR_SIG w0.102: 34.42,29.64 34.42,29.65 34.41,29.66 34.41,29.97 34.63,30.19 34.96,30.19 ; 33.63,28.8 33.63,28.83 33.61,28.86 33.61,29.17 33.85,29.41 34.19,29.41
  L6_PWR_SIG w0.305: v1(117.62,63.45) 116.4,62.23 110.95,62.23 110.7,61.98 107.03,61.98 106.35,61.3 106.35,54.97 103.63,52.25 102.15,52.25 101.37,51.47 101.37,43.13 JP1.1
  BOTTOM w0.483: C353.2 53.55,35.48 v1(53.55,35.47)
  vias: v1(33.19,28.21) v1(52.73,42.21) v1(52.73,41.33) v1(53.4,34.53) v1(53.8,42.19) v1(53.8,41.3) v1(54.86,42.21) v1(55.91,42.21) v1(55.91,41.33)
+1.8V_VDDOUTA: length 7.7
  TOP w0.483: v1(20.97,37.55) 20.97,36.99 ; 20.97,36.99 20.97,36.53 v1(20.97,36.52) 20.97,36.97 v1(20.95,36.98) 20.97,36.99
  BOTTOM w0.483: C400.1 21.49,36.98 v1(20.95,36.98) ; L9.1 v1(21.13,18.03) v1(21.13,18.56) C364.2 21.12,19.05 v1(21.1,19.08) 21.35,19.33 C179.1 ; v1(20.97,37.55) 20.97,37.54 v1(20.97,36.52) 20.95,36.51 L10.1
  vias: v1(18.72,28.19) v1(19.56,28.17) v1(20.42,28.17) v1(21.29,28.14) v1(101.55,28.85) v1(101.6,27.99) v1(101.6,27.1) v1(102.51,28.83) v1(102.57,27.97) v1(102.57,27.08) v1(103.48,28.8) v1(103.53,27.94) v1(103.53,27.05)
+1.8V_VDDR: length 4.7
  TOP w0.381: v1(35.59,28.21) 35.79,28.6 v1(35.59,29.01) 35.41,28.6 v1(35.59,28.21)
  L4_SIG w0.381: v1(35.59,29.01) v1(35.59,28.21)
  BOTTOM w0.381: 35.41,28.6 v1(35.59,28.21) 35.79,28.6 v1(35.59,29.01) 35.41,28.6
  BOTTOM w0.508: C356.2 61.88,28.32 v1(61.82,28.37)
  vias: v1(61.42,31.04) v1(61.44,30.15) v1(62.36,31.01) v1(62.36,30.12) v1(63.22,31.04) v1(63.22,30.15) v1(64.14,31.01) v1(64.14,30.15) v2(62.17,29.28)
+1.8V_VDDS: length 8.5
  TOP w0.381: v2(34.42,23.22) v1(33.99,23.41) v2(34.39,23.6) v1(34.79,23.41) v2(34.42,23.22)
  L4_SIG w0.381: 34.39,23.41 v1(33.99,23.41) 34.19,23.22 v2(34.42,23.22) 34.42,23.41 ; 34.39,23.41 34.42,23.41 ; 34.39,23.41 v2(34.39,23.6) 34.61,23.6 v1(34.79,23.41) 34.42,23.41
  L6_PWR_SIG w0.127: 36.97,21.61 36.71,21.35 36.34,21.35 36.23,21.46 36.17,21.46 ; 35.18,21.97 35.18,21.96 35.14,21.93 35.14,21.56 35.4,21.3 35.85,21.3 36.04,21.49
  BOTTOM w0.305: v1(69.54,27.2) 69.54,27.2 C358.2
  BOTTOM w0.381: v1(33.99,23.41) v2(34.42,23.22) v1(34.79,23.41) v2(34.39,23.6) v1(33.99,23.41)
  vias: v1(70.71,29.16) v1(70.71,28.22) v1(70.74,27.36) v1(71.78,29.16) v1(71.78,28.24) v1(71.81,27.41) v1(72.82,28.22) v1(72.85,27.38) v1(72.87,29.16)
+1.8V_VDDTX: length 0.3
  BOTTOM w0.305: C374.2 v1(38.56,15.16)
  vias: v1(31.59,23.41) v1(80.47,29.06) v1(80.47,28.04) v1(80.47,27.15) v1(81.61,29.06) v1(81.61,28.04) v1(81.61,27.15) v1(82.75,29.06) v1(82.75,28.04) v1(82.75,27.15)
+1.8V_VDDVCO: length 6.6
  TOP w0.381: v1(29.99,25.81) 30.15,25.5 v1(29.99,25.01) 29.79,25.43 v1(29.99,25.81)
  L3_PWR w0.102: 29.59,24.08 29.59,24.26 ; 29.59,24.08 29.35,23.83 29.03,23.83 28.86,24 28.83,24 ; 29.59,24.08 29.61,24.06 29.61,24.05 29.83,23.83 30.15,23.83 30.37,24.05 30.37,24.13
  L3_PWR w0.127: 26.8,21.95 26.8,21.54 26.64,21.39
  BOTTOM w0.381: v1(29.99,25.81) 30.15,25.5 v1(29.99,25.01) 29.79,25.43 v1(29.99,25.81)
  BOTTOM w0.483: v1(22.44,13.34) 22.44,13.33 C352.2
  vias: v1(25.4,19.08) v1(88.75,27.99) v1(88.77,28.91) v1(88.77,27.1) v1(89.76,28.91) v1(89.76,27.99) v1(89.79,27.08) v1(90.78,28.88) v1(90.78,27.94) v1(90.78,27.08)
+3.3VCLK: length 9.8
  TOP w0.483: v4(105.54,49.28) v4(106.3,49.28) 106.3,48.56 v4(106.25,48.51) ; v4(106.25,48.51) 105.54,49.23 v4(105.54,48.51) v4(106.25,48.51)
  BOTTOM w0.305: v3(102.21,47.96) 101.24,48.92 101.24,52.17 100.91,52.5 U21.3
  vias: v1(133.15,59.21) v1(137.57,63.96) v3(102.06,46.86) v3(102.49,49.63) v3(102.92,48.62) v3(102.92,47.78) v3(102.92,46.86) v3(103.48,49.3) v3(103.56,48.21) v3(103.58,47.29) v3(120.46,49.3) v4(105.46,52.04) v4(105.46,51.28) v4(105.54,47.37) v4(105.54,46.61) v4(106.22,52.04) v4(106.17,51.33) v4(106.25,46.58) v4(106.3,47.37) v4(107.95,56.64) v4(107.95,55.88) v4(108.71,56.64) v4(108.71,55.88) v4(109.98,63.37) v4(109.98,62.61) v4(110.74,63.37) v4(110.74,62.89) v4(120.14,45.09) v4(120.14,44.32) v4(120.4,58.88) v4(120.4,56.64) v4(120.9,45.09) v4(120.9,44.32) v4(120.98,49.82) v4(120.98,48.75) v4(121.52,49.28) v4(134.9,65.76) v4(134.92,64.69) v4(135.31,65.23) v4(135.71,65.76) v4(135.71,64.69)
+3.3VIO:
  vias: v1(46.43,65) v1(47.32,65.02) v1(48.16,65) v1(49.02,64.97)
+5VIN: length 62.4
  TOP w0.305: v1(94.28,52.5) 94.79,53.01 C312.2 ; U31.13 64.22,61 v1(63.88,60.66) ; U12.10 76.37,59.75 75.11,61.01 C415.1 ; v1(62.76,62.64) 62.77,62.64 U31.11 ; U31.10 62.56,63.14 v1(62.46,63.04) ; U31.12 62.8,62.14 v1(62.76,62.1) ; U19.1 v1(51.29,49.21)
  L3_PWR w0.305: 95.99,41.4 96.27,41.12 102.79,41.12 103.61,40.31 113.39,40.31 114.27,39.42 115.41,39.42 116.25,40.26 128.02,40.26 132.28,35.99 v1(133.25,35.99)
  L6_PWR_SIG w0.305: v2(66.04,51.64) v2(65.56,51.64) 65.76,51.84 65.76,52.7 63.98,54.48 63.22,54.48 62.61,55.09 v1(62.61,58.47)
  L6_PWR_SIG w0.508: v1(133.25,30.66) v1(133.25,33.32) v1(133.25,35.99)
  BOTTOM w0.305: U21.13 v1(94.28,52.5)
  vias: v1(34.04,66.47) v1(34.06,64.69) v1(34.11,65.56) v1(34.92,66.5) v1(35.13,64.67) v1(35.26,65.58) v1(35.86,66.47) v1(36.09,65.02) v1(36.8,66.5) v1(36.83,65.63) v1(37.19,64.69) v1(38.33,64.69) v1(43.23,63.09) v1(43.87,65.89) v1(44.45,66.67) v1(44.4,65) v1(44.83,65.86) v1(45.26,65) v1(45.34,66.73) v1(49.5,48.77) v1(49.5,48.13) v1(49.94,48.49) v1(50.39,48.77) v1(50.39,48.13) v1(54.84,52.58) v1(61.75,58.52) v1(61.77,59.61) v1(62.18,59.05) v1(62.59,59.61) v1(74.85,61.57) v1(75.36,60.83) v1(82.47,64.41) v1(83.44,64.08) v1(84.12,64.69) v1(84.86,64.08) v1(85.5,64.72) v1(86.18,64.19) v1(86.89,64.72) v1(94.61,54.48) v1(94.87,55.12) v1(95.01,53.8) v1(95.25,54.48) v1(95.5,55.12) v1(96.16,55.09) v2(66.32,63.14) v2(66.83,63.14)
-1.8V_VEE: length 35.2
  TOP w0.381: v1(29.19,25.01) v2(29.18,25.4) 28.96,25.53 ; v1(29.19,25.01) 29.29,25.58 ; v1(29.19,25.01) 28.96,25.53 ; 29.29,25.58 v1(29.19,25.81) 28.96,25.53 ; 29.29,25.58 28.96,25.53 ; v1(29.19,29.81) 29.42,30.2 v1(29.19,30.61) 29.19,30.56 28.98,30.2 29.03,29.97 v1(29.19,29.81)
  L4_SIG w0.381: v1(29.19,29.81) v1(29.19,30.61) ; v1(29.19,25.01) v1(29.19,25.81)
  L6_PWR_SIG w0.102: 28.7,26.04 28.55,26.19 28.23,26.19 28.07,26.03 27.94,26.03
  L6_PWR_SIG w0.127: v1(34.73,42.23) 34.73,42.32 35.75,43.35 35.75,43.8 36.35,44.4 41.61,44.4 43.43,46.23 v1(45.49,46.23)
  BOTTOM w0.127: R125.1 53.85,49.12 50.95,46.23 v1(45.49,46.23)
  BOTTOM w0.305: v1(29.19,30.61) 29.13,30.3 28.98,30.2 v1(29.19,29.81)
  BOTTOM w0.381: v1(29.19,29.81) v1(29.19,30.61) ; v1(29.19,29.81) 29.06,29.95 C177.1 ; v1(29.19,29.81) 29.42,30.2 v1(29.19,30.61) ; v1(29.19,30.61) 29.05,30.76 C165.1 ; C164.1 29.05,25.68 v1(29.19,25.81) ; C176.1 29.07,24.89 v1(29.19,25.01) ; v1(29.19,25.01) 29.13,25.26 28.96,25.53 v1(29.19,25.81) ; v1(29.19,25.01) v2(29.18,25.4) v1(29.19,25.81)
  BOTTOM w0.508: v1(27.46,35.44) 27.43,35.46 C357.2
  vias: v1(31.96,42.26) v1(31.93,41.27) v1(32.82,41.27) v1(32.9,42.26) v1(33.79,42.26) v1(33.79,41.27) v1(34.78,41.24)
GND: length 3347.7
  TOP w0.254: 27.82,18.6 v1(27.58,18.36) 27.56,18.34 ; 31.11,18.6 31.11,22.11 31.06,22.17
  TOP w0.305: v1(27.59,24.21) 27.67,24.21 28.39,24.93 v1(28.39,25.01) ; v4(79.96,41.73) 79.78,41.55 C381.2 ; 63.93,54.94 64.44,55.45 v1(64.59,55.45) ; 63.93,54.94 U37.18 v4(63.93,52.85) ; 63.93,54.94 63.93,55.12 63.58,55.47 v1(63.45,55.47) ; v1(25.51,23.26) 24.94,22.7 24.94,21.13 25.15,20.93 v1(25.15,20.8) ; v2(26.47,22.56) 26.44,22.53 v2(26.44,21.69) 26.37,21.62 26.37,21.08 v2(26.16,20.88) ; C115.2 33.37,20.6 v2(34.01,19.96) 34.01,19.86 v2(34.39,19.48) 35.53,18.34 v2(35.53,18.29) ; v1(27.59,31.41) 27.67,31.41 28.39,30.69 v1(28.39,30.61) ; U31.6 65.22,63.14 v1(64.97,62.89) ; v3(76.27,57.29) 76.22,57.24 U12.12 ; R68.2 34.42,53.19 v1(34.52,53.09) ; v1(28.39,25.81) 28.39,25.92 27.69,26.61 v1(27.59,26.61) ; v1(64.72,60.27) U31.14 64.72,62.64 v1(64.97,62.89) ; v4(80.87,42.65) 81.05,42.82 C383.2 ; v1(25.66,19.69) 25.7,19.69 26.12,19.28 26.12,19.23 R3.2 ; v4(80.87,41.73) 81.03,41.58 C380.2 ; v1(64.97,62.89) 65.22,62.64 U31.15 v1(65.22,60.61) ; C382.2 80.37,39.65 v1(80.52,39.5) ; R283.2 v4(115.16,53.59) ; R287.2 v4(113.64,52.3) ; v1(97.66,49.12) 97.36,49.43 R131.1 ; v5(52.21,49.91) 52.18,49.88 U19.2 52.18,48.77 v1(51.92,48.51) ; 32.99,33.6 32.99,32.02 v1(32.39,31.41) ; U37.8 v4(63.93,51.45) ; 27.82,18.6 27.82,20.35 28.14,20.67 ; v1(28.39,29.81) 28.39,29.74 27.67,29.01 v1(27.59,29.01)
  TOP w0.381: v1(30.79,22.61) v1(30.79,23.41) ; v1(30.79,29.01) v1(29.99,29.01) v1(29.19,29.01) v1(28.39,29.81) v1(28.39,30.61) ; 32.99,33.6 32.99,34.29 v1(32.96,34.33) ; v1(30.79,26.61) v1(29.99,26.61) v1(29.19,26.61) v1(28.39,25.81) v1(28.39,25.01) v1(28.39,24.21) v1(28.39,23.41) v1(28.39,22.61) ; v1(35.59,27.41) v1(35.59,26.61) v1(35.59,25.81) v1(35.59,25.01) v1(35.59,23.41) 35.59,21.75 35.59,21.74 ; v1(32.39,31.41) v1(33.19,30.61) v1(33.99,30.61) v1(34.79,30.61) v1(35.59,30.61) v1(35.59,29.81)
  TOP w0.432: 107.77,30.82 J24.5 ; J24.5 109,33.71 ; J24.5 106.54,33.71 ; J24.5 106.11,32.49 ; J24.5 107.77,34.15 ; J24.5 109.44,32.49 ; J24.5 106.54,31.26 ; J24.5 109,31.26 ; JP1.3 103.09,38.09 ; JP1.3 101.33,38.09 ; JP1.3 101.04,37.21 ; JP1.3 101.33,36.33 ; JP1.3 103.09,36.33 ; JP1.3 102.21,36.04 ; JP1.3 103.38,37.21 ; JP1.3 102.21,38.38 ; J24.3 114.52,37.57 ; J24.3 112.85,39.23 ; J24.3 111.19,37.57 ; J24.3 112.85,35.9 ; J24.3 111.62,38.79 ; J24.3 111.62,36.34 ; J24.3 114.08,36.34 ; J24.3 114.08,38.79 ; 94.37,38.09 J11.2 ; J11.2 96.13,38.09 ; J11.2 96.42,37.21 ; J11.2 95.25,38.38 ; J11.2 96.13,36.33 ; 90.31,59.1 J4.5 ; J4.5 89.88,60.33 ; J4.5 91.54,61.99 ; J4.5 92.77,61.55 ; J4.5 90.31,61.55 ; 112.85,30.82 J24.4 ; J24.4 112.85,34.15 ; J24.4 111.62,31.26 ; J24.4 114.52,32.49 ; J24.4 111.19,32.49 ; J24.4 114.08,31.26 ; J24.4 111.62,33.71 ; J24.4 114.08,33.71 ; TP1.1 72.24,36.19 ; TP1.1 72.54,35.28 ; TP1.1 72.24,34.37 ; TP1.1 70.1,35.28 ; TP1.1 70.41,34.37 ; TP1.1 71.32,36.5 ; TP1.1 70.41,36.19 ; TP1.1 71.32,34.06 ; J25.2 126.7,49.72 ; J25.2 126.7,46.39 ; J25.2 125.47,49.28 ; J25.2 128.36,48.06 ; J25.2 125.47,46.83 ; J25.2 125.03,48.06 ; J25.2 127.92,46.83 ; 14.83,28.3 TP14.1 ; TP14.1 13.92,28.6 ; TP14.1 13.92,30.43 ; TP14.1 15.75,28.6 ; TP14.1 16.05,29.51 ; TP14.1 13.61,29.51 ; TP14.1 15.75,30.43 ; TP14.1 14.83,30.73 ; J8.2 117.93,34.15 ; J8.2 116.7,31.26 ; J8.2 116.7,33.71 ; J8.2 119.16,33.71 ; J8.2 116.27,32.49 ; J21.3 15.75,57.35 ; J21.3 14.05,61.39 ; J21.3 14.05,56.72 ; J21.3 16.38,59.05 ; J21.3 12.34,57.35 ; J21.3 12.34,60.76 ; J21.3 11.71,59.05 ; J26.5 45.86,1.54 ; J26.5 44.63,4.43 ; J26.5 46.29,2.77 ; J26.5 44.63,1.1 ; J26.5 42.96,2.77 ; J26.5 45.86,4 ; J26.5 43.4,1.54 ; J26.5 43.4,4 ; J11.10 96.13,48.25 ; J11.10 94.37,46.49 ; J11.10 95.25,46.2 ; J11.10 94.08,47.37 ; J11.10 96.13,46.49 ; J11.10 95.25,48.54 ; J11.10 96.42,47.37 ; J11.10 94.37,48.25 ; TP2.1 107.85,63.6 ; TP2.1 106.93,63.3 ; TP2.1 106.02,63.6 ; TP2.1 105.71,64.52 ; TP2.1 107.85,65.43 ; TP2.1 108.15,64.52 ; TP2.1 106.02,65.43 ; TP2.1 106.93,65.74 ; J11.8 96.42,44.83 ; J11.8 95.25,46 ; J11.8 94.37,45.71 ; J11.8 95.25,43.66 ; J11.8 96.13,43.95 ; J11.8 94.08,44.83 ; J11.8 94.37,43.95 ; J11.8 96.13,45.71 ; 94.08,39.75 J11.4 ; J11.4 96.13,38.87 ; J11.4 94.37,38.87 ; J11.4 95.25,38.58 ; J11.4 94.37,40.63 ; J11.4 96.42,39.75 ; J11.4 96.13,40.63 ; J11.4 95.25,40.92 ; 107.77,35.9 J24.2 ; J24.2 106.54,36.34 ; J24.2 109,36.34 ; J24.2 106.11,37.57 ; J24.2 109.44,37.57 ; J24.2 106.54,38.79 ; J24.2 109,38.79 ; J24.2 107.77,39.23 ; 94.37,41.41 J11.6 ; J11.6 95.25,41.12 ; J11.6 96.13,41.41 ; J11.6 95.25,43.46 ; J11.6 96.13,43.17 ; J11.6 94.08,42.29 ; J11.6 96.42,42.29 ; J11.6 94.37,43.17 ; 90.41,46.22 JP2.3 ; JP2.3 90.41,44.46 ; JP2.3 92.16,44.46 ; JP2.3 91.29,46.51 ; JP2.3 92.16,46.22 ; JP2.3 91.29,44.17 ; JP2.3 92.46,45.34 ; JP2.3 90.12,45.34 ; J8.4 123.01,39.23 ; J8.4 124.24,36.34 ; J8.4 124.24,38.79 ; J8.4 124.68,37.57 ; J8.4 121.78,36.34 ; J8.4 121.35,37.57 ; J8.4 121.78,38.79 ; J21.2 10.79,66.19 ; J21.2 8.46,63.86 ; J21.2 9.09,62.15 ; J21.2 10.79,61.52 ; J21.2 9.09,65.56 ; J21.2 12.5,65.56 ; J21.2 12.5,62.15 ; SW1.1 115.8,65.79 ; SW1.1 114.68,66.18 ; SW1.1 115.8,63.55 ; SW1.1 113.56,63.55 ; SW1.1 116.19,64.67 ; SW1.1 114.68,63.16 ; SW1.1 113.56,65.79 ; SW1.1 113.17,64.67 ; J25.4 133,44.2 ; J25.4 130.11,42.98 ; J25.4 133.44,42.98 ; J25.4 133,41.75 ; J25.4 130.55,44.2 ; J25.4 130.55,41.75 ; J25.4 131.78,41.31 ; J25.4 131.78,44.64 ; J26.3 49.71,9.51 ; J26.3 49.71,6.18 ; J26.3 48.04,7.85 ; J26.3 48.48,9.08 ; J26.3 50.94,9.08 ; J26.3 50.94,6.62 ; J26.3 51.37,7.85 ; J26.3 48.48,6.62 ; J4.2 92.77,64.18 ; J4.2 90.31,64.18 ; J4.2 90.31,66.63 ; J4.2 89.88,65.41 ; J4.2 92.77,66.63 ; J4.2 91.54,63.74 ; J4.2 93.21,65.41 ; J4.2 91.54,67.07 ; 48.48,4 J26.4 ; J26.4 48.48,1.54 ; J26.4 48.04,2.77 ; J26.4 50.94,1.54 ; J26.4 51.37,2.77 ; J26.4 50.94,4 ; J26.4 49.71,1.1 ; J26.4 49.71,4.43 ; 42.96,7.85 J26.2 ; J26.2 43.4,9.08 ; J26.2 46.29,7.85 ; J26.2 44.63,6.18 ; J26.2 45.86,9.08 ; J26.2 45.86,6.62 ; J26.2 43.4,6.62 ; J26.2 44.63,9.51 ; 116.7,36.34 J8.3 ; J8.3 117.93,35.9 ; J8.3 119.6,37.57 ; J8.3 116.7,38.79 ; J8.3 117.93,39.23 ; J8.3 119.16,36.34 ; J8.3 116.27,37.57 ; 96.62,58.66 J4.4 ; J4.4 97.85,61.55 ; J4.4 95.39,59.1 ; J4.4 98.29,60.33 ; J4.4 97.85,59.1 ; J25.5 127.92,44.2 ; J25.5 125.47,41.75 ; J25.5 127.92,41.75 ; J25.5 126.7,41.31 ; J25.5 125.03,42.98 ; J25.5 125.47,44.2 ; J25.5 128.36,42.98 ; J25.5 126.7,44.64 ; J8.5 124.68,32.49 ; J8.5 123.01,30.82 ; J8.5 124.24,31.26 ; J8.5 124.24,33.71 ; J8.5 121.78,31.26 ; J4.3 97.85,66.63 ; J4.3 96.62,63.74 ; J4.3 94.96,65.41 ; J4.3 95.39,66.63 ; J4.3 95.39,64.18 ; J4.3 96.62,67.07 ; J4.3 98.29,65.41 ; J4.3 97.85,64.18 ; J25.3 133,49.28 ; J25.3 131.78,46.39 ; J25.3 133.44,48.06 ; J25.3 130.11,48.06 ; J25.3 133,46.83 ; J25.3 130.55,46.83 ; J25.3 130.55,49.28 ; J25.3 131.78,49.72 ; JP9.1 60.83,64.9 ; JP9.1 59.66,63.73 ; JP9.1 58.5,63.73 ; JP9.1 58.5,66.07 ; JP9.1 60.83,63.73 ; JP9.1 58.5,64.9 ; JP9.1 60.83,66.07 ; JP9.1 59.66,66.07
  TOP w0.483: C54.1 111.05,43.94 v1(110.87,43.76) ; C143.2 56.18,33.28 v1(56.18,33.28) ; v4(92.84,39.7) 92.85,39.69 U34.4
  TOP w0.508: 116.71,54.1 116.71,53.54 v4(116.94,53.31) ; v4(116.94,52.3) 117.04,52.2 117.04,51.38 v4(116.94,51.28) 116.79,51.13 C63.1 116.79,50.42 v4(116.94,50.27) ; v4(110.85,48.23) 110.62,48.46 C56.1 ; v4(110.85,51.28) 110.62,51.05 110.62,50.5 v4(110.85,50.27) ; v1(25.39,16.91) 25.39,16.92 R2.2 ; v3(99.01,53.2) 99.11,53.1 C315.2 ; 99.06,54.1 99.06,53.95 v3(99.01,53.9) ; v4(116.94,47.22) 117.04,47.12 C64.1 ; v3(96.21,53.9) 96.16,53.95 C313.1 ; R129.1 96.21,51.9 v3(96.21,52.5) v3(96.21,53.2) ; v4(110.85,53.31) 110.52,53.64 C52.1 ; R130.1 96.22,51.1 v3(96.21,51.1) ; C61.2 111.79,47.14 v4(111.86,47.22) ; T8.1 v1(43.57,14.22) ; R266.2 v1(4.62,20.75) ; C55.1 110.62,46.99 v4(110.85,47.22) ; C75.2 v1(39.04,47.78) ; v4(111.86,53.31) 111.66,53.52 C53.1 ; C139.2 v1(25.66,20.59) ; v1(34.7,55.19) 34.37,55.58 C86.1
  L2_GND w0.432: J4.4 97.85,61.55 ; J4.4 98.29,60.33 ; J4.4 94.96,60.33 ; J4.4 97.85,59.1 ; J4.4 95.39,61.55 ; J4.4 95.39,59.1 ; J4.4 96.62,58.66 ; J4.4 96.62,61.99 ; 68.77,52.29 JP8.1 ; JP8.1 70.52,50.53 ; JP8.1 69.65,50.24 ; JP8.1 68.77,50.53 ; JP8.1 70.52,52.29 ; JP8.1 70.82,51.41 ; JP8.1 69.65,52.58 ; JP8.1 68.48,51.41 ; JP2.3 92.46,45.34 ; JP2.3 90.12,45.34 ; JP2.3 92.16,44.46 ; JP2.3 90.41,46.22 ; JP2.3 92.16,46.22 ; JP2.3 91.29,46.51 ; JP2.3 90.41,44.46 ; JP2.3 91.29,44.17 ; 43.4,4 J26.5 ; J26.5 43.4,1.54 ; J26.5 42.96,2.77 ; J26.5 46.29,2.77 ; J26.5 45.86,4 ; J26.5 44.63,4.43 ; J26.5 44.63,1.1 ; J26.5 45.86,1.54 ; 94.08,42.29 J11.6 ; J11.6 96.42,42.29 ; J11.6 96.13,41.41 ; J11.6 94.37,41.41 ; J11.6 95.25,43.46 ; J11.6 95.25,41.12 ; J11.6 94.37,43.17 ; J11.6 96.13,43.17 ; J24.4 114.08,33.71 ; J24.4 114.08,31.26 ; J24.4 111.19,32.49 ; J24.4 111.62,31.26 ; J24.4 112.85,34.15 ; J24.4 114.52,32.49 ; J24.4 112.85,30.82 ; J24.4 111.62,33.71 ; 106.93,63.3 TP2.1 ; TP2.1 106.93,65.74 ; TP2.1 106.02,65.43 ; TP2.1 105.71,64.52 ; TP2.1 107.85,65.43 ; TP2.1 108.15,64.52 ; TP2.1 107.85,63.6 ; TP2.1 106.02,63.6 ; 95.39,64.18 J4.3 ; J4.3 97.85,66.63 ; J4.3 94.96,65.41 ; J4.3 96.62,63.74 ; J4.3 96.62,67.07 ; J4.3 97.85,64.18 ; J4.3 98.29,65.41 ; J4.3 95.39,66.63 ; J25.2 126.7,49.72 ; J25.2 125.47,46.83 ; J25.2 127.92,46.83 ; J25.2 126.7,46.39 ; J25.2 128.36,48.06 ; J25.2 127.92,49.28 ; J25.2 125.03,48.06 ; J25.2 125.47,49.28 ; 116.7,36.34 J8.3 ; J8.3 117.93,35.9 ; J8.3 116.7,38.79 ; J8.3 119.6,37.57 ; J8.3 119.16,38.79 ; J8.3 119.16,36.34 ; J8.3 117.93,39.23 ; J8.3 116.27,37.57 ; 89.88,60.33 J4.5 ; J4.5 90.31,61.55 ; J4.5 93.21,60.33 ; J4.5 90.31,59.1 ; J4.5 92.77,59.1 ; J4.5 91.54,61.99 ; J4.5 92.77,61.55 ; J4.5 91.54,58.66 ; J25.5 127.92,44.2 ; J25.5 125.47,44.2 ; J25.5 126.7,41.31 ; J25.5 128.36,42.98 ; J25.5 125.03,42.98 ; J25.5 127.92,41.75 ; J25.5 126.7,44.64 ; J25.5 125.47,41.75 ; 79.36,2.92 MT4.1 ; MT4.1 82.86,1.44 ; MT4.1 82.86,4.4 ; MT4.1 81.38,4.94 ; MT4.1 81.38,0.9 ; MT4.1 79.9,1.44 ; MT4.1 83.4,2.92 ; MT4.1 79.9,4.4 ; J25.3 133,49.28 ; J25.3 130.55,49.28 ; J25.3 133,46.83 ; J25.3 133.44,48.06 ; J25.3 131.78,49.72 ; J25.3 130.55,46.83 ; J25.3 130.11,48.06 ; J25.3 131.78,46.39 ; J11.4 96.42,39.75 ; J11.4 96.13,40.63 ; J11.4 94.37,38.87 ; J11.4 96.13,38.87 ; J11.4 94.37,40.63 ; J11.4 95.25,38.58 ; J11.4 94.08,39.75 ; J11.4 95.25,40.92 ; J25.4 133,41.75 ; J25.4 131.78,41.31 ; J25.4 130.55,44.2 ; J25.4 133.44,42.98 ; J25.4 130.55,41.75 ; J25.4 131.78,44.64 ; J25.4 133,44.2 ; J25.4 130.11,42.98 ; J4.2 91.54,67.07 ; J4.2 93.21,65.41 ; J4.2 92.77,64.18 ; J4.2 90.31,64.18 ; J4.2 89.88,65.41 ; J4.2 90.31,66.63 ; J4.2 91.54,63.74 ; J4.2 92.77,66.63 ; 15.39,55.05 MT3.1 ; MT3.1 18.34,55.05 ; MT3.1 18.34,52.09 ; MT3.1 14.85,53.57 ; MT3.1 18.89,53.57 ; MT3.1 15.39,52.09 ; MT3.1 16.87,55.59 ; MT3.1 16.87,51.55 ; J26.4 51.37,2.77 ; J26.4 48.04,2.77 ; J26.4 49.71,1.1 ; J26.4 50.94,4 ; J26.4 49.71,4.43 ; J26.4 48.48,4 ; J26.4 48.48,1.54 ; J26.4 50.94,1.54 ; 70.41,34.37 TP1.1 ; TP1.1 72.54,35.28 ; TP1.1 72.24,36.19 ; TP1.1 72.24,34.37 ; TP1.1 70.41,36.19 ; TP1.1 71.32,34.06 ; TP1.1 71.32,36.5 ; TP1.1 70.1,35.28 ; 106.54,33.71 J24.5 ; J24.5 106.54,31.26 ; J24.5 106.11,32.49 ; J24.5 107.77,30.82 ; J24.5 107.77,34.15 ; J24.5 109.44,32.49 ; J24.5 109,31.26 ; J24.5 109,33.71 ; J8.2 117.93,34.15 ; J8.2 116.7,31.26 ; J8.2 119.16,31.26 ; J8.2 116.27,32.49 ; J8.2 119.16,33.71 ; J8.2 117.93,30.82 ; J8.2 119.6,32.49 ; J8.2 116.7,33.71 ; 19.95,62.98 TP22.1 ; TP22.1 19.95,60.62 ; TP22.1 22.32,60.62 ; TP22.1 22.32,62.98 ; TP22.1 21.13,60.2 ; TP22.1 19.53,61.8 ; TP22.1 22.73,61.8 ; TP22.1 21.13,63.4 ; JP1.3 103.09,38.09 ; JP1.3 102.21,38.38 ; JP1.3 103.38,37.21 ; JP1.3 101.33,38.09 ; JP1.3 102.21,36.04 ; JP1.3 101.04,37.21 ; JP1.3 101.33,36.33 ; JP1.3 103.09,36.33 ; J26.2 46.29,7.85 ; J26.2 45.86,9.08 ; J26.2 43.4,6.62 ; J26.2 44.63,6.18 ; J26.2 43.4,9.08 ; J26.2 45.86,6.62 ; J26.2 42.96,7.85 ; J26.2 44.63,9.51 ; 8.46,63.86 J21.2 ; J21.2 12.5,65.56 ; J21.2 10.79,66.19 ; J21.2 12.5,62.15 ; J21.2 9.09,62.15 ; J21.2 13.13,63.86 ; J21.2 9.09,65.56 ; J21.2 10.79,61.52 ; J24.3 112.85,39.23 ; J24.3 111.62,36.34 ; J24.3 112.85,35.9 ; J24.3 114.08,38.79 ; J24.3 111.19,37.57 ; J24.3 111.62,38.79 ; J24.3 114.08,36.34 ; J24.3 114.52,37.57 ; J26.3 49.71,9.51 ; J26.3 48.48,9.08 ; J26.3 50.94,9.08 ; J26.3 50.94,6.62 ; J26.3 48.48,6.62 ; J26.3 51.37,7.85 ; J26.3 48.04,7.85 ; J26.3 49.71,6.18 ; J11.10 95.25,48.54 ; J11.10 94.37,48.25 ; J11.10 95.25,46.2 ; J11.10 96.13,48.25 ; J11.10 96.13,46.49 ; J11.10 94.08,47.37 ; J11.10 94.37,46.49 ; J11.10 96.42,47.37 ; J21.3 14.05,61.39 ; J21.3 11.71,59.05 ; J21.3 15.75,60.76 ; J21.3 15.75,57.35 ; J21.3 14.05,56.72 ; J21.3 12.34,60.76 ; J21.3 16.38,59.05 ; J21.3 12.34,57.35 ; J8.5 124.68,32.49 ; J8.5 123.01,34.15 ; J8.5 123.01,30.82 ; J8.5 121.78,31.26 ; J8.5 124.24,31.26 ; J8.5 121.78,33.71 ; J8.5 121.35,32.49 ; J8.5 124.24,33.71 ; SW1.1 116.19,64.67 ; SW1.1 114.68,66.18 ; SW1.1 113.56,65.79 ; SW1.1 114.68,63.16 ; SW1.1 115.8,63.55 ; SW1.1 113.17,64.67 ; SW1.1 115.8,65.79 ; SW1.1 113.56,63.55 ; 16.66,4.15 MT2.1 ; MT2.1 19.61,4.15 ; MT2.1 18.14,4.69 ; MT2.1 16.66,1.19 ; MT2.1 19.61,1.19 ; MT2.1 16.12,2.67 ; MT2.1 18.14,0.65 ; MT2.1 20.16,2.67 ; 94.37,38.09 J11.2 ; J11.2 94.37,36.33 ; J11.2 96.13,36.33 ; J11.2 95.25,36.04 ; J11.2 96.13,38.09 ; J11.2 94.08,37.21 ; J11.2 95.25,38.38 ; J11.2 96.42,37.21 ; TP14.1 15.75,28.6 ; TP14.1 16.05,29.51 ; TP14.1 14.83,30.73 ; TP14.1 14.83,28.3 ; TP14.1 13.92,30.43 ; TP14.1 13.61,29.51 ; TP14.1 15.75,30.43 ; TP14.1 13.92,28.6 ; 94.08,44.83 J11.8 ; J11.8 95.25,43.66 ; J11.8 96.13,45.71 ; J11.8 96.42,44.83 ; J11.8 96.13,43.95 ; J11.8 94.37,43.95 ; J11.8 95.25,46 ; J11.8 94.37,45.71 ; MT1.1 76.06,64.37 ; MT1.1 73.1,64.37 ; MT1.1 76.6,65.85 ; MT1.1 73.1,67.33 ; MT1.1 76.06,67.33 ; MT1.1 74.58,67.87 ; MT1.1 72.56,65.85 ; MT1.1 74.58,63.83 ; 121.78,38.79 J8.4 ; J8.4 121.78,36.34 ; J8.4 124.24,36.34 ; J8.4 123.01,39.23 ; J8.4 124.68,37.57 ; J8.4 121.35,37.57 ; J8.4 124.24,38.79 ; J8.4 123.01,35.9 ; 106.54,36.34 J24.2 ; J24.2 109,36.34 ; J24.2 106.11,37.57 ; J24.2 109,38.79 ; J24.2 107.77,35.9 ; J24.2 109.44,37.57 ; J24.2 107.77,39.23 ; J24.2 106.54,38.79 ; 58.79,64.02 JP9.1 ; JP9.1 58.79,65.77 ; JP9.1 60.83,64.9 ; JP9.1 59.66,66.07 ; JP9.1 59.66,63.73 ; JP9.1 58.5,64.9 ; JP9.1 60.54,65.77 ; JP9.1 60.54,64.02
  L4_SIG w0.432: 130.55,44.2 J25.4 ; J25.4 130.55,41.75 ; J25.4 133,44.2 ; J25.4 131.78,44.64 ; J25.4 133,41.75 ; J25.4 133.44,42.98 ; J25.4 131.78,41.31 ; J25.4 130.11,42.98 ; J26.3 50.94,9.08 ; J26.3 49.71,6.18 ; J26.3 49.71,9.51 ; J26.3 48.48,6.62 ; J26.3 48.04,7.85 ; J26.3 48.48,9.08 ; J26.3 50.94,6.62 ; J26.3 51.37,7.85 ; TP2.1 108.15,64.52 ; TP2.1 105.71,64.52 ; TP2.1 106.93,63.3 ; TP2.1 107.85,65.43 ; TP2.1 107.85,63.6 ; TP2.1 106.02,63.6 ; TP2.1 106.02,65.43 ; 123.01,30.82 J8.5 ; J8.5 124.24,33.71 ; J8.5 124.68,32.49 ; J8.5 121.78,33.71 ; J8.5 121.35,32.49 ; J8.5 123.01,34.15 ; J8.5 121.78,31.26 ; J8.5 124.24,31.26 ; 94.37,38.87 J11.4 ; J11.4 96.13,38.87 ; J11.4 96.42,39.75 ; J11.4 94.08,39.75 ; J11.4 95.25,38.58 ; JP9.1 59.66,66.07 ; JP9.1 58.5,64.9 ; JP9.1 58.79,65.77 ; JP9.1 60.83,64.9 ; JP9.1 60.54,65.77 ; 117.93,30.82 J8.2 ; J8.2 119.6,32.49 ; J8.2 119.16,31.26 ; J8.2 117.93,34.15 ; J8.2 116.27,32.49 ; J8.2 116.7,31.26 ; J8.2 119.16,33.71 ; J8.2 116.7,33.71 ; 69.65,50.24 JP8.1 ; JP8.1 70.82,51.41 ; JP8.1 70.52,50.53 ; JP8.1 68.77,50.53 ; JP8.1 69.65,52.58 ; JP8.1 70.52,52.29 ; JP8.1 68.77,52.29 ; JP8.1 68.48,51.41 ; 130.55,46.83 J25.3 ; J25.3 133,49.28 ; J25.3 133.44,48.06 ; J25.3 130.55,49.28 ; J25.3 131.78,49.72 ; J25.3 130.11,48.06 ; J25.3 131.78,46.39 ; J25.3 133,46.83 ; MT3.1 18.34,52.09 ; MT3.1 18.34,55.05 ; MT3.1 15.39,52.09 ; MT3.1 16.87,55.59 ; MT3.1 16.87,51.55 ; J26.4 50.94,4 ; J26.4 51.37,2.77 ; J26.4 48.48,1.54 ; J26.4 48.04,2.77 ; J26.4 49.71,4.43 ; J26.4 50.94,1.54 ; J26.4 49.71,1.1 ; J26.4 48.48,4 ; 12.34,57.35 J21.3 ; J21.3 15.75,60.76 ; J21.3 11.71,59.05 ; J21.3 14.05,61.39 ; J21.3 15.75,57.35 ; J21.3 12.34,60.76 ; J21.3 16.38,59.05 ; J21.3 14.05,56.72 ; 126.7,46.39 J25.2 ; J25.2 127.92,49.28 ; J25.2 125.03,48.06 ; J25.2 125.47,49.28 ; J25.2 128.36,48.06 ; J25.2 125.47,46.83 ; J25.2 127.92,46.83 ; J25.2 126.7,49.72 ; 94.96,65.41 J4.3 ; J4.3 95.39,66.63 ; J4.3 96.62,67.07 ; J4.3 98.29,65.41 ; J4.3 97.85,66.63 ; 121.35,37.57 J8.4 ; J8.4 123.01,35.9 ; J8.4 124.68,37.57 ; J8.4 124.24,36.34 ; J8.4 121.78,36.34 ; J8.4 124.24,38.79 ; J8.4 123.01,39.23 ; J8.4 121.78,38.79 ; 90.41,44.46 JP2.3 ; JP2.3 90.41,46.22 ; JP2.3 91.29,46.51 ; JP2.3 92.46,45.34 ; JP2.3 90.12,45.34 ; JP2.3 92.16,46.22 ; JP2.3 92.16,44.46 ; JP2.3 91.29,44.17 ; J11.8 96.42,44.83 ; J11.8 94.37,43.95 ; J11.8 94.37,45.71 ; J11.8 95.25,46 ; J11.8 96.13,43.95 ; J11.8 96.13,45.71 ; J11.8 94.08,44.83 ; J11.6 96.39,42.78 ; J11.6 94.11,41.8 ; J11.6 94.08,42.29 ; J11.6 96.42,42.29 ; 95.25,46.2 J11.10 ; J11.10 94.08,47.37 ; J11.10 94.37,46.49 ; J11.10 96.13,46.49 ; J11.10 96.42,47.37 ; TP14.1 16.05,29.51 ; TP14.1 14.83,30.73 ; TP14.1 13.92,30.43 ; TP14.1 13.92,28.6 ; TP14.1 14.83,28.3 ; TP14.1 13.61,29.51 ; TP14.1 15.75,30.43 ; TP14.1 15.75,28.6 ; 44.63,6.18 J26.2 ; J26.2 42.96,7.85 ; J26.2 43.4,6.62 ; J26.2 45.86,9.08 ; J26.2 44.63,9.51 ; J26.2 45.86,6.62 ; J26.2 46.29,7.85 ; J26.2 43.4,9.08 ; MT4.1 81.38,4.94 ; MT4.1 79.9,4.4 ; MT4.1 79.36,2.92 ; MT4.1 82.86,4.4 ; MT4.1 82.86,1.44 ; MT4.1 83.4,2.92 ; MT4.1 81.38,0.9 ; MT4.1 79.9,1.44 ; J24.2 109.44,37.57 ; J24.2 107.77,39.23 ; J24.2 106.54,36.34 ; J24.2 109,36.34 ; J24.2 106.11,37.57 ; J24.2 107.77,35.9 ; J24.2 109,38.79 ; J24.2 106.54,38.79 ; 112.85,35.9 J24.3 ; J24.3 111.19,37.57 ; J24.3 114.52,37.57 ; J24.3 111.62,36.34 ; J24.3 114.08,36.34 ; J24.3 114.08,38.79 ; J24.3 112.85,39.23 ; J24.3 111.62,38.79 ; 113.17,64.67 SW1.1 ; SW1.1 114.68,63.16 ; SW1.1 113.56,63.55 ; SW1.1 115.8,63.55 ; SW1.1 116.19,64.67 ; J21.2 12.5,62.15 ; J21.2 9.09,65.56 ; J21.2 12.5,65.56 ; J21.2 8.46,63.86 ; J21.2 10.79,61.52 ; J21.2 10.79,66.19 ; J21.2 9.09,62.15 ; J21.2 13.13,63.86 ; 90.31,59.1 J4.5 ; J4.5 91.54,58.66 ; J4.5 91.54,61.99 ; J4.5 90.31,61.55 ; J4.5 92.77,59.1 ; J4.5 92.77,61.55 ; J4.5 89.88,60.33 ; J4.5 93.21,60.33 ; MT2.1 18.14,4.69 ; MT2.1 18.14,0.65 ; MT2.1 16.66,1.19 ; MT2.1 19.61,1.19 ; MT2.1 16.12,2.67 ; MT2.1 20.16,2.67 ; MT2.1 19.61,4.15 ; MT2.1 16.66,4.15 ; 42.96,2.77 J26.5 ; J26.5 43.4,1.54 ; J26.5 44.63,4.43 ; J26.5 45.86,1.54 ; J26.5 46.29,2.77 ; J26.5 43.4,4 ; J26.5 45.86,4 ; J26.5 44.63,1.1 ; 91.54,63.74 J4.2 ; J4.2 92.77,66.63 ; J4.2 90.31,66.63 ; J4.2 90.31,64.18 ; J4.2 93.21,65.41 ; J4.2 91.54,67.07 ; J4.2 89.88,65.41 ; TP22.1 22.32,62.98 ; TP22.1 19.53,61.8 ; TP22.1 19.95,60.62 ; TP22.1 21.13,63.4 ; TP22.1 21.13,60.2 ; TP22.1 22.73,61.8 ; TP22.1 19.95,62.98 ; 116.7,38.79 J8.3 ; J8.3 117.93,39.23 ; J8.3 119.16,38.79 ; J8.3 119.16,36.34 ; J8.3 117.93,35.9 ; J8.3 116.27,37.57 ; J8.3 119.6,37.57 ; J8.3 116.7,36.34 ; 125.03,42.98 J25.5 ; J25.5 126.7,44.64 ; J25.5 125.47,41.75 ; J25.5 128.36,42.98 ; J25.5 127.92,44.2 ; J25.5 125.47,44.2 ; J25.5 126.7,41.31 ; J25.5 127.92,41.75 ; 102.21,36.04 JP1.3 ; JP1.3 103.09,38.09 ; JP1.3 101.33,36.33 ; JP1.3 103.38,37.21 ; JP1.3 103.09,36.33 ; 107.77,30.82 J24.5 ; J24.5 106.54,33.71 ; J24.5 109,31.26 ; J24.5 106.11,32.49 ; J24.5 109.44,32.49 ; J24.5 109,33.71 ; J24.5 107.77,34.15 ; J24.5 106.54,31.26 ; MT1.1 76.06,67.33 ; MT1.1 73.1,67.33 ; MT1.1 76.6,65.85 ; MT1.1 74.58,63.83 ; MT1.1 76.06,64.37 ; MT1.1 72.56,65.85 ; MT1.1 73.1,64.37 ; MT1.1 74.58,67.87 ; J24.4 112.85,34.15 ; J24.4 114.08,31.26 ; J24.4 111.19,32.49 ; J24.4 112.85,30.82 ; J24.4 114.08,33.71 ; J24.4 111.62,31.26 ; J24.4 114.52,32.49 ; J24.4 111.62,33.71 ; J11.2 95.25,38.38 ; J11.2 96.13,38.09 ; J11.2 94.08,37.21 ; J11.2 96.42,37.21 ; J11.2 94.37,38.09 ; J4.4 96.62,61.99 ; J4.4 95.39,61.55 ; J4.4 97.85,61.55 ; J4.4 98.29,60.33 ; J4.4 94.96,60.33
  L5_GND w0.432: J8.3 117.93,39.23 ; J8.3 119.16,36.34 ; J8.3 119.6,37.57 ; J8.3 116.27,37.57 ; J8.3 116.7,36.34 ; J8.3 116.7,38.79 ; J8.3 117.93,35.9 ; J8.3 119.16,38.79 ; 106.11,37.57 J24.2 ; J24.2 106.54,36.34 ; J24.2 109,36.34 ; J24.2 107.77,39.23 ; J24.2 109,38.79 ; J24.2 109.44,37.57 ; J24.2 107.77,35.9 ; J24.2 106.54,38.79 ; MT1.1 76.06,67.33 ; MT1.1 74.58,67.87 ; MT1.1 73.1,67.33 ; MT1.1 76.06,64.37 ; MT1.1 73.1,64.37 ; MT1.1 74.58,63.83 ; MT1.1 76.6,65.85 ; MT1.1 72.56,65.85 ; 13.61,29.51 TP14.1 ; TP14.1 16.05,29.51 ; TP14.1 13.92,28.6 ; TP14.1 14.83,28.3 ; TP14.1 15.75,30.43 ; TP14.1 14.83,30.73 ; TP14.1 13.92,30.43 ; TP14.1 15.75,28.6 ; 48.48,9.08 J26.3 ; J26.3 49.71,6.18 ; J26.3 50.94,9.08 ; J26.3 51.37,7.85 ; J26.3 48.04,7.85 ; J26.3 50.94,6.62 ; J26.3 48.48,6.62 ; J26.3 49.71,9.51 ; J21.3 15.75,60.76 ; J21.3 14.05,61.39 ; J21.3 16.38,59.05 ; J21.3 11.71,59.05 ; J21.3 12.34,60.76 ; J21.3 14.05,56.72 ; J21.3 12.34,57.35 ; J21.3 15.75,57.35 ; 113.17,64.67 SW1.1 ; SW1.1 113.56,65.79 ; SW1.1 116.19,64.67 ; SW1.1 114.68,63.16 ; SW1.1 115.8,65.79 ; SW1.1 113.56,63.55 ; SW1.1 114.68,66.18 ; SW1.1 115.8,63.55 ; J24.5 109,33.71 ; J24.5 106.11,32.49 ; J24.5 107.77,34.15 ; J24.5 106.54,31.26 ; J24.5 107.77,30.82 ; J24.5 106.54,33.71 ; J24.5 109.44,32.49 ; J24.5 109,31.26 ; 44.63,6.18 J26.2 ; J26.2 45.86,6.62 ; J26.2 42.96,7.85 ; J26.2 45.86,9.08 ; J26.2 43.4,9.08 ; J26.2 43.4,6.62 ; J26.2 46.29,7.85 ; J26.2 44.63,9.51 ; 102.21,36.04 JP1.3 ; JP1.3 103.09,36.33 ; JP1.3 101.04,37.21 ; JP1.3 101.33,36.33 ; JP1.3 101.33,38.09 ; JP1.3 103.09,38.09 ; JP1.3 103.38,37.21 ; JP1.3 102.21,38.38 ; J11.4 95.25,40.92 ; J11.4 96.13,40.63 ; J11.4 94.37,40.63 ; J11.4 96.42,39.75 ; J11.4 96.13,38.87 ; J11.4 95.25,38.58 ; J11.4 94.37,38.87 ; J11.4 94.08,39.75 ; J8.2 119.6,32.49 ; J8.2 116.27,32.49 ; J8.2 116.7,33.71 ; J8.2 116.7,31.26 ; J8.2 117.93,34.15 ; J8.2 119.16,31.26 ; J8.2 119.16,33.71 ; J8.2 117.93,30.82 ; 91.29,44.17 JP2.3 ; JP2.3 92.16,46.22 ; JP2.3 90.12,45.34 ; JP2.3 90.41,46.22 ; JP2.3 92.46,45.34 ; JP2.3 90.41,44.46 ; JP2.3 92.16,44.46 ; JP2.3 91.29,46.51 ; 121.78,31.26 J8.5 ; J8.5 121.35,32.49 ; J8.5 121.78,33.71 ; J8.5 123.01,30.82 ; J8.5 124.24,31.26 ; J8.5 124.24,33.71 ; J8.5 123.01,34.15 ; J8.5 124.68,32.49 ; 48.04,2.77 J26.4 ; J26.4 49.71,1.1 ; J26.4 50.94,4 ; J26.4 48.48,1.54 ; J26.4 51.37,2.77 ; J26.4 48.48,4 ; J26.4 49.71,4.43 ; J26.4 50.94,1.54 ; 81.38,0.9 MT4.1 ; MT4.1 82.86,4.4 ; MT4.1 81.38,4.94 ; MT4.1 83.4,2.92 ; MT4.1 79.9,4.4 ; MT4.1 79.36,2.92 ; MT4.1 79.9,1.44 ; MT4.1 82.86,1.44 ; 130.11,42.98 J25.4 ; J25.4 130.55,41.75 ; J25.4 133,41.75 ; J25.4 131.78,44.64 ; J25.4 133.44,42.98 ; J25.4 131.78,41.31 ; J25.4 133,44.2 ; J25.4 130.55,44.2 ; 16.87,51.55 MT3.1 ; MT3.1 18.89,53.57 ; MT3.1 16.87,55.59 ; MT3.1 15.39,52.09 ; MT3.1 18.34,55.05 ; MT3.1 14.85,53.57 ; MT3.1 15.39,55.05 ; MT3.1 18.34,52.09 ; 94.37,38.09 J11.2 ; J11.2 96.13,38.09 ; J11.2 94.37,36.33 ; J11.2 96.13,36.33 ; J11.2 96.42,37.21 ; J11.2 95.25,38.38 ; J11.2 95.25,36.04 ; J11.2 94.08,37.21 ; 95.25,46.2 J11.10 ; J11.10 94.08,47.37 ; J11.10 96.13,48.25 ; J11.10 95.25,48.54 ; J11.10 96.42,47.37 ; J11.10 94.37,46.49 ; J11.10 94.37,48.25 ; J11.10 96.13,46.49 ; MT2.1 19.61,1.19 ; MT2.1 19.61,4.15 ; MT2.1 20.16,2.67 ; MT2.1 16.12,2.67 ; MT2.1 18.14,0.65 ; MT2.1 16.66,1.19 ; MT2.1 18.14,4.69 ; MT2.1 16.66,4.15 ; J11.6 95.25,43.46 ; J11.6 96.42,42.29 ; J11.6 94.08,42.29 ; J11.6 96.13,41.41 ; J11.6 94.37,43.17 ; J11.6 96.13,43.17 ; J11.6 95.25,41.12 ; J11.6 94.37,41.41 ; J25.2 127.92,46.83 ; J25.2 125.47,49.28 ; J25.2 126.7,49.72 ; J25.2 127.92,49.28 ; J25.2 126.7,46.39 ; J25.2 128.36,48.06 ; J25.2 125.03,48.06 ; J25.2 125.47,46.83 ; 112.85,35.9 J24.3 ; J24.3 114.52,37.57 ; J24.3 112.85,39.23 ; J24.3 111.62,36.34 ; J24.3 111.62,38.79 ; J24.3 111.19,37.57 ; J24.3 114.08,36.34 ; J24.3 114.08,38.79 ; JP8.1 69.65,52.58 ; JP8.1 70.52,52.29 ; JP8.1 68.77,50.53 ; JP8.1 70.52,50.53 ; JP8.1 68.77,52.29 ; JP8.1 68.48,51.41 ; JP8.1 69.65,50.24 ; JP8.1 70.82,51.41 ; 130.55,49.28 J25.3 ; J25.3 131.78,46.39 ; J25.3 130.11,48.06 ; J25.3 133.44,48.06 ; J25.3 131.78,49.72 ; J25.3 130.55,46.83 ; J25.3 133,49.28 ; J25.3 133,46.83 ; 125.47,41.75 J25.5 ; J25.5 127.92,44.2 ; J25.5 127.92,41.75 ; J25.5 125.03,42.98 ; J25.5 126.7,41.31 ; J25.5 126.7,44.64 ; J25.5 128.36,42.98 ; J25.5 125.47,44.2 ; 95.39,61.55 J4.4 ; J4.4 97.85,61.55 ; J4.4 97.85,59.1 ; J4.4 98.29,60.33 ; J4.4 96.62,58.66 ; J4.4 94.96,60.33 ; J4.4 96.62,61.99 ; J4.4 95.39,59.1 ; J21.2 12.5,62.15 ; J21.2 8.46,63.86 ; J21.2 9.09,65.56 ; J21.2 9.09,62.15 ; J21.2 12.5,65.56 ; J21.2 10.79,61.52 ; J21.2 10.79,66.19 ; J21.2 13.13,63.86 ; 121.78,36.34 J8.4 ; J8.4 121.78,38.79 ; J8.4 123.01,39.23 ; J8.4 123.01,35.9 ; J8.4 124.24,36.34 ; J8.4 121.35,37.57 ; J8.4 124.68,37.57 ; J8.4 124.24,38.79 ; J24.4 114.08,31.26 ; J24.4 111.62,31.26 ; J24.4 111.19,32.49 ; J24.4 111.62,33.71 ; J24.4 114.52,32.49 ; J24.4 114.08,33.71 ; J24.4 112.85,34.15 ; J24.4 112.85,30.82 ; J11.8 95.25,46 ; J11.8 94.37,43.95 ; J11.8 96.13,43.95 ; J11.8 96.13,45.71 ; J11.8 95.25,43.66 ; J11.8 94.37,45.71 ; J11.8 94.08,44.83 ; J11.8 96.42,44.83 ; 71.32,34.06 TP1.1 ; TP1.1 72.24,34.37 ; TP1.1 70.41,36.19 ; TP1.1 70.41,34.37 ; TP1.1 72.54,35.28 ; TP1.1 70.1,35.28 ; TP1.1 71.32,36.5 ; TP1.1 72.24,36.19 ; TP22.1 22.32,62.98 ; TP22.1 19.95,62.98 ; TP22.1 22.73,61.8 ; TP22.1 21.13,63.4 ; TP22.1 21.13,60.2 ; TP22.1 22.32,60.62 ; TP22.1 19.53,61.8 ; TP22.1 19.95,60.62 ; 95.39,64.18 J4.3 ; J4.3 94.96,65.41 ; J4.3 95.39,66.63 ; J4.3 97.85,64.18 ; J4.3 98.29,65.41 ; J4.3 97.85,66.63 ; J4.3 96.62,63.74 ; J4.3 96.62,67.07 ; 91.54,58.66 J4.5 ; J4.5 90.31,59.1 ; J4.5 91.54,61.99 ; J4.5 92.77,59.1 ; J4.5 93.21,60.33 ; J4.5 92.77,61.55 ; J4.5 89.88,60.33 ; J4.5 90.31,61.55 ; J4.2 93.21,65.41 ; J4.2 91.54,67.07 ; J4.2 90.31,64.18 ; J4.2 89.88,65.41 ; J4.2 90.31,66.63 ; J4.2 92.77,64.18 ; J4.2 92.77,66.63 ; J4.2 91.54,63.74 ; J26.5 44.63,4.43 ; J26.5 43.4,1.54 ; J26.5 45.86,4 ; J26.5 45.86,1.54 ; J26.5 43.4,4 ; J26.5 44.63,1.1 ; J26.5 42.96,2.77 ; J26.5 46.29,2.77 ; 106.02,65.43 TP2.1 ; TP2.1 106.93,63.3 ; TP2.1 106.93,65.74 ; TP2.1 107.85,63.6 ; TP2.1 106.02,63.6 ; TP2.1 108.15,64.52 ; TP2.1 107.85,65.43 ; TP2.1 105.71,64.52 ; JP9.1 60.83,64.9 ; JP9.1 60.54,65.77 ; JP9.1 58.79,65.77 ; JP9.1 60.54,64.02 ; JP9.1 59.66,66.07 ; JP9.1 59.66,63.73 ; JP9.1 58.79,64.02 ; JP9.1 58.5,64.9
  L6_PWR_SIG w0.432: 116.27,32.49 J8.2 ; J8.2 117.93,34.15 ; J8.2 116.7,33.71 ; J8.2 119.6,32.49 ; J8.2 117.93,30.82 ; J8.2 119.16,33.71 ; J8.2 119.16,31.26 ; J8.2 116.7,31.26 ; 106.02,65.43 TP2.1 ; TP2.1 106.02,63.6 ; TP2.1 108.15,64.52 ; TP2.1 107.85,63.6 ; TP2.1 106.93,65.74 ; TP2.1 105.71,64.52 ; TP2.1 106.93,63.3 ; TP2.1 107.85,65.43 ; J25.2 127.92,49.28 ; J25.2 125.03,48.06 ; J25.2 125.47,49.28 ; J25.2 126.7,46.39 ; J25.2 127.92,46.83 ; J25.2 128.36,48.06 ; J25.2 126.7,49.72 ; J21.2 12.5,65.56 ; J21.2 10.79,61.52 ; J21.2 9.09,62.15 ; J21.2 8.46,63.86 ; J21.2 9.09,65.56 ; J21.2 12.5,62.15 ; J21.2 10.79,66.19 ; J11.6 96.42,42.29 ; J11.6 95.25,43.46 ; J11.6 96.13,43.17 ; J11.6 95.25,41.12 ; J11.6 96.13,41.41 ; 126.7,41.31 J25.5 ; J25.5 127.92,41.75 ; J25.5 125.47,44.2 ; J25.5 125.03,42.98 ; J25.5 126.7,44.64 ; J25.4 133.44,42.98 ; J25.4 133,41.75 ; J25.4 133,44.2 ; J25.4 131.78,41.31 ; J25.4 130.11,42.98 ; J25.4 131.78,44.64 ; J25.4 130.55,41.75 ; J25.4 130.55,44.2 ; J4.2 91.54,67.07 ; J4.2 92.77,66.63 ; J4.2 93.21,65.41 ; J4.2 92.77,64.18 ; J4.2 90.31,66.63 ; J4.4 96.62,61.99 ; J4.4 98.29,60.33 ; J4.4 97.85,61.55 ; J4.4 97.85,59.1 ; J4.4 95.39,59.1 ; J4.4 95.39,61.55 ; J4.4 96.62,58.66 ; MT4.1 82.86,4.4 ; MT4.1 79.9,1.44 ; MT4.1 79.9,4.4 ; MT4.1 81.38,4.94 ; MT4.1 82.86,1.44 ; MT4.1 79.36,2.92 ; MT4.1 83.4,2.92 ; MT4.1 81.38,0.9 ; 94.08,39.75 J11.4 ; J11.4 96.42,39.75 ; J11.4 95.25,40.92 ; J11.4 96.13,40.63 ; J11.4 95.25,38.58 ; J11.4 94.37,38.87 ; J11.4 96.13,38.87 ; J24.4 114.52,32.49 ; J24.4 112.85,34.15 ; J24.4 111.19,32.49 ; J24.4 114.08,33.71 ; J24.4 111.62,31.26 ; J24.4 112.85,30.82 ; J24.4 114.08,31.26 ; J24.4 111.62,33.71 ; 96.62,63.74 J4.3 ; J4.3 98.29,65.41 ; J4.3 95.39,64.18 ; J4.3 97.85,66.63 ; J4.3 95.39,66.63 ; J4.3 97.85,64.18 ; J4.3 96.62,67.07 ; J4.3 94.96,65.41 ; J25.3 131.78,49.72 ; J25.3 133,49.28 ; J25.3 130.11,48.06 ; J25.3 130.55,49.28 ; J25.3 133.44,48.06 ; J25.3 133,46.83 ; J25.3 131.78,46.39 ; J25.3 130.55,46.83 ; J24.5 107.77,34.15 ; J24.5 106.54,31.26 ; J24.5 106.11,32.49 ; J24.5 107.77,30.82 ; J24.5 109.44,32.49 ; J24.5 109,33.71 ; J24.5 109,31.26 ; J24.5 106.54,33.71 ; MT3.1 16.87,55.59 ; MT3.1 18.89,53.57 ; MT3.1 14.85,53.57 ; MT3.1 16.87,51.55 ; MT3.1 15.39,52.09 ; MT3.1 18.34,55.05 ; MT3.1 15.39,55.05 ; MT3.1 18.34,52.09 ; 123.01,35.9 J8.4 ; J8.4 124.24,36.34 ; J8.4 121.78,36.34 ; J8.4 121.78,38.79 ; J8.4 123.01,39.23 ; J8.4 121.35,37.57 ; J8.4 124.68,37.57 ; 58.5,64.9 JP9.1 ; JP9.1 58.79,65.77 ; JP9.1 59.66,66.07 ; JP9.1 60.54,65.77 ; JP9.1 58.79,64.02 ; JP9.1 60.83,64.9 ; JP9.1 59.66,63.73 ; JP9.1 60.54,64.02 ; MT2.1 20.16,2.67 ; MT2.1 18.14,0.65 ; MT2.1 18.14,4.69 ; MT2.1 16.66,1.19 ; MT2.1 19.61,4.15 ; MT2.1 16.66,4.15 ; MT2.1 16.12,2.67 ; MT2.1 19.61,1.19 ; J11.8 96.42,44.83 ; J11.8 95.25,43.66 ; J11.8 96.13,45.71 ; J11.8 95.25,46 ; J11.8 96.13,43.95 ; J11.10 95.25,48.54 ; J11.10 95.25,46.2 ; J11.10 96.42,47.37 ; J11.10 96.13,46.49 ; J11.10 96.13,48.25 ; J11.2 96.42,37.21 ; J11.2 94.37,38.09 ; J11.2 94.08,37.21 ; J11.2 96.13,38.09 ; J11.2 95.25,38.38 ; TP1.1 72.54,35.28 ; TP1.1 71.32,34.06 ; TP1.1 71.32,36.5 ; TP1.1 72.24,34.37 ; TP1.1 72.24,36.19 ; TP1.1 70.41,34.37 ; TP1.1 70.41,36.19 ; TP1.1 70.1,35.28 ; 121.78,31.26 J8.5 ; J8.5 121.78,33.71 ; J8.5 124.24,31.26 ; J8.5 121.35,32.49 ; J8.5 123.01,34.15 ; J8.5 123.01,30.82 ; J8.5 124.24,33.71 ; 73.1,67.33 MT1.1 ; MT1.1 72.56,65.85 ; MT1.1 76.06,67.33 ; MT1.1 74.58,63.83 ; MT1.1 76.6,65.85 ; MT1.1 74.58,67.87 ; MT1.1 73.1,64.37 ; 102.21,36.04 JP1.3 ; JP1.3 101.33,36.33 ; JP1.3 103.09,36.33 ; JP1.3 101.04,37.21 ; JP1.3 103.38,37.21 ; JP1.3 103.09,38.09 ; JP1.3 102.21,38.38 ; JP1.3 101.33,38.09 ; 113.17,64.67 SW1.1 ; SW1.1 115.8,65.79 ; SW1.1 113.56,63.55 ; SW1.1 113.56,65.79 ; SW1.1 116.19,64.67 ; SW1.1 115.8,63.55 ; SW1.1 114.68,66.18 ; SW1.1 114.68,63.16 ; 116.7,36.34 J8.3 ; J8.3 116.7,38.79 ; J8.3 119.16,36.34 ; J8.3 119.6,37.57 ; J8.3 119.16,38.79 ; J8.3 116.27,37.57 ; J8.3 117.93,39.23 ; J8.3 117.93,35.9 ; J24.2 109,36.34 ; J24.2 106.54,36.34 ; J24.2 109,38.79 ; J24.2 109.44,37.57 ; J24.2 107.77,35.9 ; J24.2 107.77,39.23 ; J24.2 106.54,38.79 ; J24.2 106.11,37.57 ; JP8.1 70.52,50.53 ; JP8.1 69.65,52.58 ; JP8.1 70.52,52.29 ; JP8.1 68.48,51.41 ; JP8.1 69.65,50.24 ; JP8.1 68.77,52.29 ; JP8.1 70.82,51.41 ; JP8.1 68.77,50.53 ; TP14.1 15.75,28.6 ; TP14.1 13.92,28.6 ; TP14.1 14.83,30.73 ; TP14.1 13.92,30.43 ; TP14.1 15.75,30.43 ; TP14.1 13.61,29.51 ; TP14.1 14.83,28.3 ; TP14.1 16.05,29.51 ; J21.3 15.75,57.35 ; J21.3 11.71,59.05 ; J21.3 14.05,56.72 ; J21.3 12.34,60.76 ; J21.3 12.34,57.35 ; J24.3 114.08,36.34 ; J24.3 111.62,36.34 ; J24.3 112.85,35.9 ; J24.3 111.19,37.57 ; J24.3 114.08,38.79 ; J24.3 112.85,39.23 ; J24.3 114.52,37.57 ; J24.3 111.62,38.79
  L7_GND w0.432: 73.1,67.33 MT1.1 ; MT1.1 76.06,64.37 ; MT1.1 76.6,65.85 ; MT1.1 76.06,67.33 ; MT1.1 72.56,65.85 ; MT1.1 74.58,63.83 ; MT1.1 73.1,64.37 ; MT1.1 74.58,67.87 ; J26.2 44.63,9.51 ; J26.2 45.86,9.08 ; J26.2 45.86,6.62 ; J26.2 42.96,7.85 ; J26.2 43.4,6.62 ; J26.2 44.63,6.18 ; J26.2 46.29,7.85 ; J26.2 43.4,9.08 ; 106.11,37.57 J24.2 ; J24.2 107.77,35.9 ; J24.2 106.54,36.34 ; J24.2 109,38.79 ; J24.2 109,36.34 ; J24.2 109.44,37.57 ; J24.2 106.54,38.79 ; J24.2 107.77,39.23 ; 116.27,37.57 J8.3 ; J8.3 119.16,36.34 ; J8.3 119.6,37.57 ; J8.3 117.93,35.9 ; J8.3 116.7,38.79 ; J8.3 117.93,39.23 ; J8.3 119.16,38.79 ; J8.3 116.7,36.34 ; J11.8 96.13,45.71 ; J11.8 96.13,43.95 ; J11.8 94.37,45.71 ; J11.8 94.08,44.83 ; J11.8 96.42,44.83 ; J11.8 95.25,46 ; J11.8 95.25,43.66 ; J11.8 94.37,43.95 ; 94.37,43.17 J11.6 ; J11.6 96.13,41.41 ; J11.6 96.13,43.17 ; J11.6 94.37,41.41 ; J11.6 96.42,42.29 ; J11.6 95.25,41.12 ; J11.6 94.08,42.29 ; J11.6 95.25,43.46 ; J11.4 96.42,39.75 ; J11.4 94.37,40.63 ; J11.4 96.13,38.87 ; J11.4 95.25,40.92 ; J11.4 95.25,38.58 ; J11.4 94.08,39.75 ; J11.4 96.13,40.63 ; J11.4 94.37,38.87 ; J4.4 98.29,60.33 ; J4.4 95.39,59.1 ; J4.4 95.39,61.55 ; J4.4 96.62,58.66 ; J4.4 96.62,61.99 ; J4.4 97.85,59.1 ; J4.4 94.96,60.33 ; J4.4 97.85,61.55 ; 90.41,46.22 JP2.3 ; JP2.3 91.29,46.51 ; JP2.3 90.41,44.46 ; JP2.3 91.29,44.17 ; JP2.3 92.16,46.22 ; JP2.3 90.12,45.34 ; JP2.3 92.16,44.46 ; JP2.3 92.46,45.34 ; J25.3 133,46.83 ; J25.3 133,49.28 ; J25.3 130.55,49.28 ; J25.3 133.44,48.06 ; J25.3 130.11,48.06 ; J25.3 131.78,49.72 ; J25.3 131.78,46.39 ; J25.3 130.55,46.83 ; 90.31,61.55 J4.5 ; J4.5 93.21,60.33 ; J4.5 92.77,59.1 ; J4.5 91.54,58.66 ; J4.5 92.77,61.55 ; J4.5 91.54,61.99 ; J4.5 89.88,60.33 ; J4.5 90.31,59.1 ; 68.77,52.29 JP8.1 ; JP8.1 68.48,51.41 ; JP8.1 69.65,52.58 ; JP8.1 70.52,52.29 ; JP8.1 70.82,51.41 ; JP8.1 68.77,50.53 ; JP8.1 69.65,50.24 ; JP8.1 70.52,50.53 ; 111.19,37.57 J24.3 ; J24.3 112.85,39.23 ; J24.3 111.62,36.34 ; J24.3 112.85,35.9 ; J24.3 114.52,37.57 ; J24.3 114.08,36.34 ; J24.3 114.08,38.79 ; J24.3 111.62,38.79 ; J26.4 50.94,1.54 ; J26.4 49.71,1.1 ; J26.4 48.04,2.77 ; J26.4 51.37,2.77 ; J26.4 49.71,4.43 ; J26.4 48.48,4 ; J26.4 48.48,1.54 ; J26.4 50.94,4 ; J26.3 49.71,9.51 ; J26.3 48.04,7.85 ; J26.3 50.94,6.62 ; J26.3 51.37,7.85 ; J26.3 48.48,9.08 ; J26.3 50.94,9.08 ; J26.3 48.48,6.62 ; J26.3 49.71,6.18 ; JP1.3 102.21,38.38 ; JP1.3 101.33,36.33 ; JP1.3 101.04,37.21 ; JP1.3 103.09,36.33 ; JP1.3 102.21,36.04 ; JP1.3 103.09,38.09 ; JP1.3 101.33,38.09 ; JP1.3 103.38,37.21 ; 94.37,38.09 J11.2 ; J11.2 96.13,38.09 ; J11.2 96.42,37.21 ; J11.2 95.25,36.04 ; J11.2 94.08,37.21 ; J11.2 95.25,38.38 ; J11.2 94.37,36.33 ; J11.2 96.13,36.33 ; 19.95,60.62 TP22.1 ; TP22.1 22.73,61.8 ; TP22.1 21.13,63.4 ; TP22.1 19.53,61.8 ; TP22.1 19.95,62.98 ; TP22.1 22.32,62.98 ; TP22.1 21.13,60.2 ; TP22.1 22.32,60.62 ; 106.93,63.3 TP2.1 ; TP2.1 108.15,64.52 ; TP2.1 107.85,65.43 ; TP2.1 106.02,63.6 ; TP2.1 105.71,64.52 ; TP2.1 106.93,65.74 ; TP2.1 107.85,63.6 ; TP2.1 106.02,65.43 ; 121.78,33.71 J8.5 ; J8.5 121.78,31.26 ; J8.5 124.24,31.26 ; J8.5 123.01,34.15 ; J8.5 124.24,33.71 ; J8.5 121.35,32.49 ; J8.5 124.68,32.49 ; J8.5 123.01,30.82 ; 125.47,44.2 J25.5 ; J25.5 127.92,41.75 ; J25.5 125.03,42.98 ; J25.5 126.7,44.64 ; J25.5 127.92,44.2 ; J25.5 125.47,41.75 ; J25.5 126.7,41.31 ; J25.5 128.36,42.98 ; J4.3 97.85,66.63 ; J4.3 97.85,64.18 ; J4.3 96.62,63.74 ; J4.3 95.39,66.63 ; J4.3 95.39,64.18 ; J4.3 96.62,67.07 ; J4.3 94.96,65.41 ; J4.3 98.29,65.41 ; 125.47,49.28 J25.2 ; J25.2 127.92,49.28 ; J25.2 127.92,46.83 ; J25.2 125.47,46.83 ; J25.2 125.03,48.06 ; J25.2 128.36,48.06 ; J25.2 126.7,49.72 ; J25.2 126.7,46.39 ; 42.96,2.77 J26.5 ; J26.5 45.86,4 ; J26.5 43.4,4 ; J26.5 44.63,1.1 ; J26.5 46.29,2.77 ; J26.5 45.86,1.54 ; J26.5 44.63,4.43 ; J26.5 43.4,1.54 ; JP9.1 60.83,64.9 ; JP9.1 58.5,64.9 ; JP9.1 58.79,65.77 ; JP9.1 59.66,66.07 ; JP9.1 59.66,63.73 ; JP9.1 60.54,65.77 ; JP9.1 60.54,64.02 ; JP9.1 58.79,64.02 ; J25.4 131.78,44.64 ; J25.4 133.44,42.98 ; J25.4 130.55,44.2 ; J25.4 131.78,41.31 ; J25.4 130.55,41.75 ; J25.4 133,44.2 ; J25.4 130.11,42.98 ; J25.4 133,41.75 ; MT2.1 19.61,4.15 ; MT2.1 16.66,1.19 ; MT2.1 18.14,0.65 ; MT2.1 18.14,4.69 ; MT2.1 16.66,4.15 ; MT2.1 20.16,2.67 ; MT2.1 16.12,2.67 ; MT2.1 19.61,1.19 ; 15.39,52.09 MT3.1 ; MT3.1 18.89,53.57 ; MT3.1 16.87,51.55 ; MT3.1 14.85,53.57 ; MT3.1 15.39,55.05 ; MT3.1 18.34,55.05 ; MT3.1 18.34,52.09 ; MT3.1 16.87,55.59 ; 11.71,59.05 J21.3 ; J21.3 14.05,56.72 ; J21.3 12.34,60.76 ; J21.3 14.05,61.39 ; J21.3 16.38,59.05 ; J21.3 12.34,57.35 ; J21.3 15.75,57.35 ; J21.3 15.75,60.76 ; J8.4 124.68,37.57 ; J8.4 123.01,39.23 ; J8.4 124.24,38.79 ; J8.4 124.24,36.34 ; J8.4 123.01,35.9 ; J8.4 121.35,37.57 ; J8.4 121.78,36.34 ; J8.4 121.78,38.79 ; 94.37,48.25 J11.10 ; J11.10 95.25,46.2 ; J11.10 96.13,46.49 ; J11.10 96.42,47.37 ; J11.10 94.08,47.37 ; J11.10 94.37,46.49 ; J11.10 95.25,48.54 ; J11.10 96.13,48.25 ; 106.11,32.49 J24.5 ; J24.5 107.77,30.82 ; J24.5 109,33.71 ; J24.5 109,31.26 ; J24.5 106.54,31.26 ; J24.5 107.77,34.15 ; J24.5 106.54,33.71 ; J24.5 109.44,32.49 ; 111.62,31.26 J24.4 ; J24.4 114.08,33.71 ; J24.4 112.85,30.82 ; J24.4 112.85,34.15 ; J24.4 114.52,32.49 ; J24.4 111.62,33.71 ; J24.4 111.19,32.49 ; J24.4 114.08,31.26 ; TP1.1 72.24,34.37 ; TP1.1 71.32,34.06 ; TP1.1 71.32,36.5 ; TP1.1 70.1,35.28 ; TP1.1 72.54,35.28 ; TP1.1 70.41,36.19 ; TP1.1 72.24,36.19 ; TP1.1 70.41,34.37 ; J8.2 119.6,32.49 ; J8.2 117.93,34.15 ; J8.2 116.27,32.49 ; J8.2 119.16,31.26 ; J8.2 116.7,31.26 ; J8.2 116.7,33.71 ; J8.2 117.93,30.82 ; J8.2 119.16,33.71 ; 90.31,64.18 J4.2 ; J4.2 92.77,64.18 ; J4.2 89.88,65.41 ; J4.2 92.77,66.63 ; J4.2 90.31,66.63 ; J4.2 93.21,65.41 ; J4.2 91.54,67.07 ; J4.2 91.54,63.74 ; J21.2 13.13,63.86 ; J21.2 10.79,61.52 ; J21.2 9.09,65.56 ; J21.2 12.5,62.15 ; J21.2 8.46,63.86 ; J21.2 12.5,65.56 ; J21.2 9.09,62.15 ; J21.2 10.79,66.19 ; 79.9,4.4 MT4.1 ; MT4.1 83.4,2.92 ; MT4.1 81.38,4.94 ; MT4.1 82.86,1.44 ; MT4.1 79.36,2.92 ; MT4.1 79.9,1.44 ; MT4.1 81.38,0.9 ; MT4.1 82.86,4.4 ; 13.92,28.6 TP14.1 ; TP14.1 15.75,30.43 ; TP14.1 13.61,29.51 ; TP14.1 15.75,28.6 ; TP14.1 16.05,29.51 ; TP14.1 14.83,28.3 ; TP14.1 14.83,30.73 ; TP14.1 13.92,30.43 ; SW1.1 115.8,65.79 ; SW1.1 116.19,64.67 ; SW1.1 113.56,65.79 ; SW1.1 114.68,66.18 ; SW1.1 115.8,63.55 ; SW1.1 114.68,63.16 ; SW1.1 113.17,64.67 ; SW1.1 113.56,63.55
  BOTTOM w0.305: v4(63.23,51.45) 62.89,51.1 R319.1 ; v3(153.06,22.96) 153.59,23.49 J20.A29 ; J20.B26 v3(152.96,27.86) ; U4.13 34.41,57.09 v1(34.54,57.23) ; v1(81.17,44.49) U30.8 81.17,42.94 v4(80.87,42.65) 80.67,42.85 U30.7 ; J20.D28 v3(149.35,25.27) ; v3(151.66,22.91) 151.13,23.44 J20.C29 ; U4.15 v1(34.57,58.09) ; J20.H36 144.83,14.61 v3(145.34,15.11) ; v3(151.89,25.5) 152.4,26.01 J20.B27 ; J20.H27 v3(145.36,25.45) ; C446.2 32.37,26.59 v1(32.39,26.61) ; v1(41.4,50.7) 41.4,50.57 41.53,50.45 41.53,49.25 U4.51 ; J20.F27 v3(147.93,25.43) ; v1(33.19,21.9) 33.18,21.89 32.77,21.89 32.4,22.27 C375.2 ; v3(97.61,51.1) U21.8 97.61,49.17 v1(97.66,49.12) ; v3(151.69,20.19) 151.18,19.69 J20.C32 ; U4.47 v1(43.18,51.59) ; J20.J8 143.51,50.19 v3(142.95,50.75) ; v1(80.17,44.52) U30.6 80.17,42.85 v4(79.96,42.65) ; v3(147.95,15.16) 147.4,14.61 J20.F36 ; v1(140.67,48.69) 140.87,48.9 J20.K9 ; v3(144.09,22.94) 143.54,23.49 J20.J29 ; v3(146.56,27.79) 146.08,27.3 J20.G26 ; U4.5 v1(34.52,53.09) ; R329.2 104.93,50.52 v1(104.8,50.65) ; C358.1 69.54,28.77 v1(69.54,28.77) ; J20.E4 148.59,55.32 v3(148.03,55.88) ; R46.2 122.53,49.73 v1(122.55,49.76) ; U4.1 v1(34.51,51.09) ; J20.H33 v3(145.26,18.9) ; v3(149.15,27.84) 148.62,27.3 J20.E26 ; C374.1 v1(40.15,15.16) ; v3(146.66,22.99) 146.15,23.49 J20.G29 ; J20.A28 v3(153.09,25.35) ; U21.7 98.26,51.05 v3(98.31,51.1) ; v3(153.09,33.1) 153.64,33.66 J20.A21 ; v1(31.59,29.01) 31.6,29.01 C125.2 ; J20.C36 v3(151.71,15.19) ; v3(153.16,18.95) 153.67,18.44 J20.A33 ; J20.J26 143.54,27.3 v3(144.07,27.84) ; v1(28.39,31.41) 28.52,31.28 C165.2 ; v3(150.52,55.88) 149.89,56.52 J20.D3 ; v1(34.7,55.19) 34.3,55.59 U4.10 ; J20.C21 151.18,33.66 v3(151.71,33.12) ; J20.D37 149.89,13.33 v3(150.44,12.78) ; v1(64.72,49.25) 64.57,49.4 R317.1 v1(65.56,49.99) ; v3(142.88,25.37) 142.24,26.01 J20.K27 ; J20.F33 147.29,18.41 v3(146.74,18.97) ; J20.C28 v3(150.57,25.32) ; v3(152.96,16.66) 152.48,17.14 J20.B34 ; 27,16.83 27,17.41 26.92,17.48 26.92,17.92 27.36,18.36 v1(27.58,18.36) ; U4.25 v1(39.06,59.11) ; U4.35 v1(43.09,57.59) ; J20.E29 v3(149.15,22.94) ; U4.11 v1(34.54,56.09)
  BOTTOM w0.381: C149.2 27.75,28.86 v1(27.59,29.01) ; C108.2 35.45,29.67 v1(35.59,29.81) ; v1(28.39,24.21) 28.56,24.38 C176.2 ; C148.2 27.6,26.61 v1(27.59,26.61) ; v1(30.79,22.61) 30.71,22.7 C161.2 ; J20.E11 J20.F12 v3(146.76,45.64) ; J20.E11 v3(149.86,47.62) ; J20.E11 148.56,46.36 v3(147.89,47.03) ; J20.E8 149.22,49.53 v3(149.4,49.53) ; J20.F21 147.29,33.66 v3(146.76,33.12) ; C177.2 28.54,30.46 v1(28.39,30.61) ; J20.G11 v3(145.49,45.8) ; C164.2 28.55,25.17 v1(28.39,25.01) ; J20.H21 v3(144.25,34.19) ; J20.E5 148.62,53.98 149.22,53.37 v3(149.4,53.37) ; C447.1 76.27,54.63 v3(76.27,55.19) ; U29.11 v1(50.31,55.53) ; J20.J11 v3(142.98,45.82)
  BOTTOM w0.432: JP8.1 70.82,52.58 ; JP8.1 70.82,51.41 ; JP8.1 68.48,51.41 ; JP8.1 68.48,52.58 ; JP8.1 69.65,50.24 ; JP8.1 68.48,50.24 ; JP8.1 69.65,52.58 ; JP8.1 70.82,50.24 ; 59.66,63.73 JP9.1 ; JP9.1 58.5,64.9 ; JP9.1 60.83,66.07 ; JP9.1 59.66,66.07 ; JP9.1 60.83,63.73 ; JP9.1 58.5,63.73 ; JP9.1 60.83,64.9 ; JP9.1 58.5,66.07 ; J4.3 97.85,66.63 ; J4.3 95.39,66.63 ; J4.3 95.39,64.18 ; J4.3 94.96,65.41 ; J4.3 96.62,63.74 ; J4.3 98.29,65.41 ; J4.3 96.62,67.07 ; J4.3 97.85,64.18 ; 90.31,64.18 J4.2 ; J4.2 93.21,65.41 ; J4.2 89.88,65.41 ; J4.2 92.77,64.18 ; J4.2 91.54,63.74 ; J4.2 90.31,66.63 ; J4.2 91.54,67.07 ; J4.2 92.77,66.63 ; TP1.1 71.32,36.5 ; TP1.1 70.1,35.28 ; TP1.1 72.24,34.37 ; TP1.1 70.41,36.19 ; TP1.1 70.41,34.37 ; TP1.1 71.32,34.06 ; TP1.1 72.54,35.28 ; TP1.1 72.24,36.19 ; 95.25,41.12 J11.6 ; J11.6 94.37,43.17 ; J11.6 94.37,41.41 ; J11.6 96.13,43.17 ; J11.6 96.13,41.41 ; J11.6 96.42,42.29 ; J11.6 95.25,43.46 ; J11.6 94.08,42.29 ; TP22.1 22.32,60.62 ; TP22.1 19.95,60.62 ; TP22.1 22.73,61.8 ; TP22.1 21.13,60.2 ; J24.4 114.52,32.49 ; J24.4 114.08,31.26 ; J24.4 112.85,30.82 ; J24.4 114.08,33.71 ; J11.2 96.13,36.33 ; J11.2 95.25,38.38 ; J11.2 96.13,38.09 ; J11.2 94.37,36.33 ; J11.2 96.42,37.21 ; J11.2 94.08,37.21 ; J11.2 94.37,38.09 ; J11.2 95.25,36.04 ; 91.29,44.17 JP2.3 ; JP2.3 92.16,46.22 ; JP2.3 92.16,44.46 ; JP2.3 90.41,44.46 ; JP2.3 90.12,45.34 ; JP2.3 92.46,45.34 ; JP2.3 90.41,46.22 ; JP2.3 91.29,46.51 ; J24.5 109,31.26 ; J24.5 109,33.71 ; J24.5 107.77,34.15 ; J24.5 109.44,32.49 ; J24.5 107.77,30.82 ; J24.5 106.54,31.26 ; J24.5 106.54,33.71 ; J25.4 133.44,42.98 ; J25.4 133,41.75 ; J25.4 131.1,41.38 ; J25.4 130.55,41.75 ; SW1.1 114.68,66.18 ; SW1.1 115.8,63.55 ; SW1.1 113.17,64.67 ; SW1.1 116.19,64.67 ; SW1.1 113.56,63.55 ; SW1.1 115.8,65.79 ; SW1.1 114.68,63.16 ; SW1.1 113.56,65.79 ; 121.78,36.34 J8.4 ; J8.4 124.24,36.34 ; J8.4 121.78,38.79 ; J8.4 124.24,38.79 ; J8.4 124.68,37.57 ; J8.4 123.01,35.9 ; J8.4 123.01,39.23 ; J8.4 121.35,37.57 ; J26.3 51.37,7.85 ; J26.3 49.71,6.18 ; J26.3 48.48,6.62 ; J26.3 50.94,6.62 ; J26.3 50.94,9.08 ; J26.3 49.71,9.51 ; J26.3 48.04,7.85 ; J26.3 48.48,9.08 ; J8.5 123.01,34.15 ; J8.5 121.78,31.26 ; J8.5 124.24,31.26 ; J8.5 121.35,32.49 ; J8.5 124.24,33.71 ; J8.5 124.68,32.49 ; J8.5 121.78,33.71 ; J8.5 123.01,30.82 ; J21.2 10.79,66.19 ; J21.2 8.46,63.86 ; J21.2 9.09,62.15 ; J21.2 10.79,61.52 ; J21.2 12.5,65.56 ; J21.2 9.09,65.56 ; J21.2 12.5,62.15 ; 117.93,35.9 J8.3 ; J8.3 119.6,37.57 ; J8.3 117.93,39.23 ; J8.3 119.16,36.34 ; J8.3 116.7,38.79 ; J8.3 116.7,36.34 ; J8.3 119.16,38.79 ; J8.3 116.27,37.57 ; J4.4 96.62,61.99 ; J4.4 95.39,61.55 ; J4.4 97.85,59.1 ; J4.4 94.96,60.33 ; J4.4 98.29,60.33 ; J4.4 97.85,61.55 ; 94.37,40.63 J11.4 ; J11.4 95.25,40.92 ; J11.4 96.42,39.75 ; J11.4 94.08,39.75 ; J11.4 96.13,40.63 ; J11.4 95.25,38.58 ; J11.4 94.37,38.87 ; J11.4 96.13,38.87 ; TP14.1 16.05,29.51 ; TP14.1 14.83,30.73 ; TP14.1 15.75,28.6 ; TP14.1 13.61,29.51 ; TP14.1 13.92,30.43 ; TP14.1 13.92,28.6 ; TP14.1 14.83,28.3 ; TP14.1 15.75,30.43 ; J25.2 128.36,48.06 ; J25.2 125.47,49.28 ; J25.2 127.92,49.28 ; J25.2 126.7,49.72 ; 48.48,1.54 J26.4 ; J26.4 50.94,4 ; J26.4 49.71,1.1 ; J26.4 50.94,1.54 ; J26.4 48.04,2.77 ; J26.4 49.71,4.43 ; J26.4 48.48,4 ; J26.4 51.37,2.77 ; 11.71,59.05 J21.3 ; J21.3 14.05,56.72 ; J21.3 12.34,60.76 ; J21.3 12.34,57.35 ; J21.3 14.05,61.39 ; J21.3 16.38,59.05 ; 130.11,48.06 J25.3 ; J25.3 133,49.28 ; J25.3 130.55,49.28 ; J25.3 131.78,49.72 ; J25.3 133.44,48.06 ; 101.04,37.21 JP1.3 ; JP1.3 102.21,38.38 ; JP1.3 101.33,36.33 ; JP1.3 103.38,37.21 ; JP1.3 103.09,38.09 ; JP1.3 101.33,38.09 ; JP1.3 102.21,36.04 ; JP1.3 103.09,36.33 ; J8.2 119.6,32.49 ; J8.2 117.93,34.15 ; J8.2 116.27,32.49 ; J8.2 119.16,33.71 ; J8.2 116.7,31.26 ; J8.2 119.16,31.26 ; J8.2 116.7,33.71 ; J8.2 117.93,30.82 ; 125.47,41.75 J25.5 ; J25.5 127.92,41.75 ; J25.5 126.02,41.38 ; J25.5 125.1,42.3 ; J26.5 45.86,4 ; J26.5 44.63,4.43 ; J26.5 46.29,2.77 ; J26.5 42.96,2.77 ; J26.5 44.63,1.1 ; J26.5 43.4,1.54 ; J26.5 43.4,4 ; J26.5 45.86,1.54 ; J26.2 45.86,9.08 ; J26.2 44.63,6.18 ; J26.2 43.4,9.08 ; J26.2 43.4,6.62 ; J26.2 45.86,6.62 ; J26.2 46.29,7.85 ; J26.2 42.96,7.85 ; J26.2 44.63,9.51 ; J24.3 114.08,36.34 ; J24.3 112.85,39.23 ; J24.3 114.52,37.57 ; J24.3 114.08,38.79 ; J24.2 109,38.79 ; J24.2 109.44,37.57 ; J24.2 109,36.34 ; J24.2 107.77,39.23 ; J24.2 107.77,35.9 ; J24.2 106.54,36.34 ; TP2.1 107.85,63.6 ; TP2.1 106.02,63.6 ; TP2.1 108.15,64.52 ; TP2.1 105.71,64.52 ; TP2.1 107.85,65.43 ; TP2.1 106.93,65.74 ; TP2.1 106.93,63.3 ; TP2.1 106.02,65.43 ; J11.8 96.13,43.95 ; J11.8 95.25,46 ; J11.8 96.13,45.71 ; J11.8 94.37,43.95 ; J11.8 95.25,43.66 ; J11.8 96.42,44.83 ; J11.8 94.37,45.71 ; J11.8 94.08,44.83 ; J11.10 96.42,47.37 ; J11.10 96.13,46.49 ; J11.10 96.13,48.25 ; J11.10 94.08,47.37 ; J11.10 95.25,46.2 ; J11.10 94.37,46.49 ; J11.10 94.37,48.25 ; J11.10 95.25,48.54 ; J4.5 93.21,60.33 ; J4.5 91.54,61.99 ; J4.5 92.77,59.1 ; J4.5 92.77,61.55 ; J4.5 91.54,58.66
  BOTTOM w0.483: C332.1 v1(17.45,16.23) ; C331.1 v1(16.31,16.28) ; 58.06,33.2 v1(58.39,33.2) 58.95,33.2 C275.2 ; 58.06,33.2 v1(57.28,33.2) 57.28,33.4 C274.2 ; 58.06,33.2 58.04,33.22 58.04,34.06 ; 39.02,19.64 v1(39.19,19.46) ; v1(55.12,35.47) 55.12,35.48 C353.1 ; v1(32.96,35.94) 32.93,35.97 C343.1 ; v1(33.19,21.9) 33.44,21.9 34.02,22.48 C171.2 ; C352.1 20.87,13.33 v1(20.87,13.34) ; C342.1 v1(54.74,33.38) ; C404.1 v1(17.32,34.72) ; R243.2 76.43,40.72 v1(76.48,40.67) ; C402.1 v1(20.27,36.98) ; v1(32.96,34.33) 32.94,34.35 C345.1 ; C403.1 v1(16.21,34.72) ; C364.1 v1(20.39,18.57)
  BOTTOM w0.508: v3(100.61,47.52) 100.63,47.55 C318.2 100.43,47.96 v3(100.18,48.21) ; v1(19.15,24.44) 19.15,24.84 C349.1 ; v1(15.88,20.95) 15.88,20.95 C328.2 ; v1(63.4,28.37) 63.35,28.32 C356.1 ; v1(25.85,33.78) 26.15,33.78 C347.1 ; C357.1 25.91,35.46 v1(25.88,35.44)
  vias: v1(0.74,36.91) v1(0.76,14.25) v1(0.69,0.94) v1(0.81,50.67) v1(0.79,48.92) v1(0.81,43.74) v1(0.79,41.99) v1(0.84,25.53) v1(0.81,20.75) v1(0.81,18.75) v1(0.97,67.54) v1(0.94,65.79) v1(0.94,60.63) v1(0.91,58.88) v1(0.94,56.92) v1(0.91,55.17) v1(0.91,32.03) v1(0.91,30.3) v1(0.91,8.99) v1(0.91,7.24) v1(1.56,2.39) v1(2.08,20.75) v1(2.08,18.75) v1(2.26,54.13) v1(2.21,43.71) v1(2.21,41.99) v1(2.26,32.05) v1(2.24,30.28) v1(2.21,8.99) v1(2.29,7.24) v1(2.39,13.44) v1(2.41,0.99) v1(3.2,67.54) v1(3.17,49.53) v1(3.35,57.28) v1(3.35,20.75) v1(3.35,18.75) v1(3.33,7.24) v1(3.38,8.97) v1(3.44,2.39) v1(3.56,32.05) v1(3.53,25.5) v1(3.61,43.74) v1(3.63,41.99) v1(3.58,30.28) v1(4.22,65.79) v1(4.22,0.94) v1(4.34,11.28) v1(4.44,38.1) v1(4.44,35.56) v1(4.39,17.35) v1(4.42,5.31) v1(4.5,13.44) v1(4.62,18.75) v1(4.62,7.24) v1(4.67,8.99) v1(4.95,67.51) v1(4.93,32.08) v1(5.03,47.7) v1(5.05,43.87) v1(4.98,41.91) v1(5.05,30.15) v1(5.36,28.27) v1(5.36,7.19) v1(5.54,22.66) v1(5.64,9.5) v1(5.71,25.4) v1(5.74,15.54) v1(5.74,11.53) v1(5.82,41.88) v1(5.84,32.11) v1(5.89,20.75) v1(5.89,18.75) v1(6.07,30.25) v1(6.12,54.56) v1(6.1,43.79) v1(6.25,7.16) v1(6.32,5.41) v1(6.38,49.58) v1(6.38,39.83) v1(6.48,45.85) v1(6.55,35.36) v1(6.76,67.51) v1(6.73,9.52) v1(6.88,27) v1(6.96,11.3) v1(7.06,43.76) v1(6.98,41.94) v1(7.06,32.11) v1(7.01,23.98) v1(6.98,17.42) v1(7.09,30.25) v1(7.16,20.75) v1(7.16,18.75) v1(7.14,13.51) v1(7.26,65.71) v1(7.26,37.69) v1(7.34,60.02) v1(7.39,9.02) v1(7.39,7.16) v1(7.59,33.63) v1(7.82,57.73) v1(7.9,55.98) v1(7.87,41.99) v1(7.92,32.13) v1(8.1,25.73) v1(8.15,18.9) v1(8.08,6.22) v1(8.2,43.87) v1(8.2,30.15) v1(8.25,27.94) v1(8.18,20.75) v1(8.33,23.14) v1(8.38,15.54) v1(8.51,67.49) v1(8.59,53.01) v1(8.59,11.13) v1(8.61,9.91) v1(8.79,55.14) v1(8.84,12.24) v1(8.79,5.54) v1(8.79,4.19) v1(8.79,2.95) v1(8.79,1.65) v1(8.79,0.51) v1(8.99,39.12) v1(9.12,34.85) v1(9.14,20.75) v1(9.14,18.8) v1(9.09,7.26) v1(9.27,57.02) v1(9.27,43.82) v1(9.19,41.99) v1(9.19,32.11) v1(9.22,30.25) v1(9.45,13.39) v1(9.52,60.96) v1(10.01,22.2) v1(10.03,14.25) v1(10.16,41.96) v1(10.16,40.92) v1(10.13,37.62) v1(10.16,36.27) v1(10.13,34.82) v1(10.16,33.45) v1(10.16,32.13) v1(10.16,30.25) v1(10.13,29.39) v1(10.13,27.79) v1(10.13,25.93) v1(10.13,23.95) v1(10.13,20.83) v1(10.13,18.69) v1(10.13,17.53) v1(10.13,16.41) v1(10.13,15.32) v1(10.21,58.14) v1(10.26,56.03) v1(10.26,54.2) v1(10.26,38.96) v1(10.29,43.76) v1(10.39,67.51) v1(10.41,9.07) v1(10.41,7.24) v1(10.54,12.24) v1(10.51,6.49) v1(10.49,5.56) v1(10.49,4.14) v1(10.49,2.9) v1(10.49,1.6) v1(10.49,0.46) v1(10.69,40.03) v1(10.92,53.19) v1(11.15,60.05) v1(11.25,12.93) v1(11.2,11.76) v1(11.23,9.93) v1(11.35,43.13) v1(11.3,40.79) v1(11.61,9.07) v1(11.61,7.21) v1(11.76,22.15) v1(11.71,13.94) v1(11.84,37.62) v1(11.86,34.82) v1(11.79,33.81) v1(11.84,31.42) v1(11.84,29.39) v1(11.84,27.79) v1(11.84,25.93) v1(11.84,23.95) v1(11.86,20.73) v1(11.84,18.75) v1(11.84,17.53) v1(11.84,16.41) v1(11.84,15.29) v1(11.91,56.41) v1(11.91,53.85) v1(11.96,38.79) v1(11.89,36.3) v1(12.12,42.34) v1(12.37,67.51) v1(12.47,39.57) v1(12.42,5.03) v1(12.55,11.76) v1(12.65,34.67) v1(12.57,9.93) v1(12.6,9.07) v1(12.65,7.21) v1(12.67,32.23) v1(12.75,17.27) v1(12.78,38.28) v1(12.9,36.92) v1(12.93,20.73) v1(12.93,18.77) v1(13.06,61.93) v1(13,53.59) v1(12.98,41.53) v1(13.34,52.07) v1(13.34,23.32) v1(13.41,35.41) v1(13.44,33.02) v1(13.51,43.96) v1(13.64,30.33) v1(13.59,26.16) v1(13.67,9.07) v1(13.69,56.18) v1(13.74,54.18) v1(13.69,7.21) v1(13.79,11.76) v1(13.82,9.93) v1(13.89,14.68) v1(14.13,36.94) v1(14.2,20.7) v1(14.22,18.43) v1(14.33,44.73) v1(14.27,37.8) v1(14.27,36.25) v1(14.33,17.27) v1(14.38,41.53) v1(14.38,33.99) v1(14.48,47.45) v1(14.55,27.71) v1(14.63,42.85) v1(14.61,39.83) v1(14.73,24.66) v1(14.76,9.14) v1(14.81,22.35) v1(14.78,7.26) v1(14.86,5.08) v1(15.01,11.76) v1(15.04,9.93) v1(15.21,50.6) v1(15.23,39.27) v1(15.19,34.72) v1(15.21,16.28) v1(15.29,43.76) v1(15.67,32.38) v1(15.85,8.99) v1(15.82,7.26) v1(15.88,39.83) v1(15.98,41.58) v1(16.21,29.87) v1(16.21,11.76) v1(16.23,9.93) v1(16.46,26.19) v1(16.54,23.37) v1(16.59,39.22) v1(16.66,14.58) v1(16.76,58.34) v1(17.07,8.99) v1(17.12,7.24) v1(17.22,5.82) v1(17.27,60.2) v1(17.32,20.93) v1(17.4,39.83) v1(17.45,11.76) v1(17.48,9.93) v1(17.6,50.52) v1(17.65,41.45) v1(17.81,27.79) v1(18.16,33.35) v1(18.14,24.77) v1(18.16,22.5) v1(18.19,56.46) v1(18.24,34.72) v1(18.34,39.27) v1(18.36,8.99) v1(18.44,7.26) v1(18.52,58.32) v1(18.49,31.06) v1(18.54,16.15) v1(18.64,20.95) v1(18.75,11.76) v1(18.77,9.93) v1(19.08,39.83) v1(19.18,60.53) v1(19.23,56.44) v1(19.33,41.48) v1(19.48,34.72) v1(19.56,9.07) v1(19.68,7.39) v1(19.81,16.15) v1(19.91,39.42) v1(19.89,20.9) v1(20.02,56.36) v1(20.02,55.22) v1(20.09,42.47) v1(20.17,14.58) v1(20.17,11.76) v1(20.19,9.93) v1(20.55,31.8) v1(20.47,24.41) v1(20.6,30.81) v1(20.75,32.99) v1(20.7,22.78) v1(20.85,55.78) v1(20.8,39.83) v1(20.83,34.65) v1(20.78,9.32) v1(20.88,25.73) v1(21.08,21.06) v1(21.16,7.65) v1(21.21,29.64) v1(21.18,16.05) v1(21.36,41.48) v1(21.54,9.93) v1(21.64,0.97) v1(21.74,27.3) v1(21.74,11.79) v1(21.92,39.85) v1(21.89,39.32) v1(21.89,29.08) v1(22,26.64) v1(22,18.31) v1(22.02,5.03) v1(22.25,31.67) v1(22.25,16.23) v1(22.4,24.18) v1(22.63,23.06) v1(22.63,8.15) v1(22.76,12.51) v1(22.76,10.07) v1(22.94,35.53) v1(22.94,20.04) v1(23.04,38.63) v1(23.04,34.37) v1(23.04,30.58) v1(23.01,21.44) v1(23.09,62.92) v1(23.09,24.94) v1(23.23,50.44) v1(23.22,33.12) v1(23.27,22.45) v1(23.37,31.85) v1(23.5,23.98) v1(23.58,48.71) v1(23.62,17.09) v1(23.85,37.77) v1(23.85,8.69) v1(23.83,7.01) v1(23.88,27.28) v1(23.95,13.72) v1(23.98,62.92) v1(23.98,10.77) v1(24.1,0.91) v1(24.36,24.94) v1(24.46,36.63) v1(24.46,30.58) v1(24.4,11.58) v1(24.54,18.44) v1(24.82,62.71) v1(24.97,35.08) v1(24.97,33.81) v1(24.96,27.21) v1(24.94,14.71) v1(25.02,19.74) v1(25.15,9.5) v1(25.3,15.75) v1(25.36,12.56) v1(25.35,11.84) v1(25.38,32.36) v1(25.4,18.36) v1(25.45,5) v1(25.45,2.79) v1(25.93,31.57) v1(26.01,39.24) v1(26.14,37.64) v1(26.08,13.4) v1(26.34,48.35) v1(26.33,23.76) v1(26.47,12.93) v1(26.47,10.54) v1(26.9,0.94) v1(27.2,47.09) v1(27.2,6.93) v1(27.51,62.76) v1(27.59,23.41) v1(27.61,16.64) v1(27.63,15.65) v1(27.66,11.79) v1(27.74,42.39) v1(27.91,14.48) v1(28.07,39.27) v1(28.19,37.67) v1(28.22,2.69) v1(28.32,4.93) v1(28.42,34.65) v1(28.47,33.5) v1(28.5,12.47) v1(28.57,15.04) v1(29.06,50.62) v1(29.26,13.18) v1(29.29,59.56) v1(29.29,10.9) v1(29.64,39.27) v1(29.77,37.67) v1(29.91,48.46) v1(30,57.43) v1(30,54.33) v1(30.05,6.93) v1(30.05,4.17) v1(30.1,14.27) v1(30.07,0.99) v1(30.2,62.76) v1(30.58,20.4) v1(31.04,39.24) v1(31.17,37.64) v1(31.19,56.82) v1(31.19,53.8) v1(31.39,67.77) v1(31.47,66.34) v1(31.39,33.37) v1(31.59,27.41) v1(31.59,25.81) v1(31.65,5.21) v1(31.57,2.69) v1(31.75,14) v1(31.85,9.83) v1(31.93,65.61) v1(31.88,12.01) v1(32.17,32.41) v1(32.39,28.21) v1(32.39,25.01) v1(32.51,66.34) v1(32.59,39.27) v1(32.72,37.67) v1(32.79,13.89) v1(32.97,65.61) v1(33.15,0.89) v1(33.43,49.66) v1(33.45,15.75) v1(33.48,44.3) v1(33.48,43.48) v1(33.76,13.89) v1(33.73,9.83) v1(33.94,47.4) v1(33.93,39.27) v1(34.06,37.67) v1(34.06,15.19) v1(34.16,3.48) v1(34.26,43.87) v1(34.19,12.01) v1(34.29,67.82) v1(34.57,59) v1(34.52,14.23) v1(35.03,44.3) v1(35.05,43.48) v1(34.98,36.09) v1(35.18,37.67) v1(35.28,39.27) v1(35.28,16.95) v1(35.38,13.84) v1(35.38,2.62) v1(35.59,24.21) v1(35.76,63.93) v1(35.72,42.28) v1(35.69,41.22) v1(35.72,40.12) v1(35.86,63.12) v1(36.2,13.03) v1(36.5,43.92) v1(36.53,21.79) v1(36.47,16.92) v1(36.5,15.34) v1(36.58,42.31) v1(36.61,41.22) v1(36.58,40.1) v1(36.65,9.73) v1(36.7,63.09) v1(36.88,34.49) v1(36.91,19.48) v1(36.93,12.29) v1(36.96,0.89) v1(36.98,14.86) v1(37.08,67.82) v1(37.11,63.8) v1(37.41,39.27) v1(37.54,37.67) v1(37.49,20.14) v1(37.52,5.59) v1(37.62,59) v1(37.58,57.39) v1(37.59,14.3) v1(37.64,8.38) v1(37.82,66.73) v1(37.87,11.35) v1(38.2,43.26) v1(38.35,65.96) v1(38.33,32.18) v1(38.33,2.59) v1(38.66,33.96) v1(38.73,53.34) v1(38.71,14.3) v1(38.86,66.73) v1(38.78,13.3) v1(38.96,10.77) v1(39.09,57.73) v1(39.14,43.23) v1(39.17,16.76) v1(39.29,3.53) v1(39.45,7.39) v1(39.47,32.05) v1(39.75,34.49) v1(40.01,55.27) v1(40.06,43.23) v1(39.98,39.27) v1(40.11,37.67) v1(40.11,21.84) v1(40.11,18.87) v1(40.19,46.99) v1(40.26,17.07) v1(40.41,5.56) v1(40.59,54.41) v1(40.61,14.38) v1(40.61,9.86) v1(40.69,34.01) v1(40.69,32.08) v1(40.77,0.89) v1(40.89,67.82) v1(40.94,62.13) v1(40.97,43.23) v1(41.05,26.21) v1(41,23.67) v1(41.1,58.14) v1(41.1,56.62) v1(41.15,55.27) v1(41.12,16.92) v1(41.12,15.29) v1(41.45,64.49) v1(41.38,8.03) v1(41.38,2.9) v1(41.5,20.47) v1(41.58,28.52) v1(41.83,17.09) v1(41.91,43.23) v1(41.94,39.27) v1(42.06,63.2) v1(42.06,37.67) v1(42.04,36.6) v1(42.04,14.3) v1(42.06,12.5) v1(42.37,53.44) v1(42.37,52.43) v1(42.37,32.05) v1(42.37,16.59) v1(42.37,14.96) v1(42.52,0.89) v1(42.72,21.87) v1(42.72,19.23) v1(42.67,5.33) v1(42.95,34.21) v1(42.88,14.33) v1(43.21,43.41) v1(43.18,29.46) v1(43.36,39.27) v1(43.31,36.58) v1(43.31,24.03) v1(43.48,37.67) v1(43.51,9.86) v1(43.64,31.42) v1(43.57,12.12) v1(43.69,20.83) v1(43.87,14.96) v1(43.92,34.24) v1(43.89,26.19) v1(44.07,43.41) v1(44.27,36.88) v1(44.7,67.82) v1(44.7,64.06) v1(44.73,14.3) v1(44.83,37.64) v1(44.81,12.5) v1(44.91,43.41) v1(44.96,39.24) v1(45.16,36.88) v1(45.11,34.29) v1(45.14,31.7) v1(45.16,29.01) v1(45.14,26.34) v1(45.14,23.67) v1(45.14,21.06) v1(45.19,14.96) v1(45.36,11.3) v1(45.36,9.6) v1(45.82,43.41) v1(45.85,14.3) v1(46.08,36.6) v1(46.15,26.01) v1(46.13,20.65) v1(46.2,45.57) v1(46.2,39.24) v1(46.25,31.37) v1(46.2,28.68) v1(46.25,14.99) v1(46.33,37.64) v1(46.3,34.11) v1(46.3,9.63) v1(46.51,50.7) v1(46.53,49.58) v1(46.61,63.75) v1(46.69,43.43) v1(46.69,17.4) v1(46.71,0.89) v1(46.84,67.06) v1(46.94,12.5) v1(46.91,11.18) v1(47.17,36.25) v1(47.37,66.34) v1(47.35,50.14) v1(47.37,19.2) v1(47.42,13.78) v1(47.6,43.41) v1(47.62,21.84) v1(47.65,16.56) v1(47.68,39.27) v1(47.8,10.77) v1(47.93,62.66) v1(48.06,29.72) v1(48.01,9.68) v1(48.11,60.12) v1(48.11,44.02) v1(48.18,32.33) v1(48.31,35.13) v1(48.39,0.89) v1(48.51,67.82) v1(48.62,43.41) v1(48.62,23.7) v1(48.74,63.12) v1(48.77,26.21) v1(48.74,12.47) v1(48.95,39.27) v1(49.05,14.99) v1(49.07,44.02) v1(49.15,20.32) v1(49.5,63.55) v1(49.5,50.16) v1(49.63,43.41) v1(49.73,17.07) v1(49.78,28.04) v1(49.89,33.55) v1(50.06,11.15) v1(50.11,30.45) v1(50.24,39.27) v1(50.22,13.87) v1(50.29,58.8) v1(50.29,58.04) v1(50.29,57.28) v1(50.29,56.52) v1(50.37,37.67) v1(50.37,21.87) v1(50.32,16.59) v1(50.39,50.16) v1(50.39,35.59) v1(50.6,63.4) v1(50.6,18.87) v1(51.05,58.8) v1(51.05,58.04) v1(51.05,57.28) v1(51.05,56.52) v1(51.1,65.13) v1(51.13,45.47) v1(51.16,35.59) v1(51.21,29.31) v1(51.36,61.77) v1(51.38,32.05) v1(51.38,23.67) v1(51.38,20.85) v1(51.51,47.57) v1(51.49,26.24) v1(51.56,12.5) v1(51.54,9.68) v1(51.59,39.27) v1(51.64,33.48) v1(51.71,37.67) v1(51.77,14.99) v1(51.82,58.8) v1(51.82,58.04) v1(51.82,57.28) v1(51.82,56.52) v1(52.2,20.04) v1(52.2,0.89) v1(52.32,67.82) v1(52.35,17.07) v1(52.37,5.87) v1(52.53,28.04) v1(52.71,60.55) v1(52.96,13.86) v1(52.93,8.28) v1(52.98,39.24) v1(53.02,16.59) v1(53.05,11.07) v1(53.11,37.64) v1(53.16,21.84) v1(53.24,62.84) v1(53.19,44.07) v1(53.24,43.33) v1(53.67,29.72) v1(53.59,3.61) v1(53.72,36.75) v1(53.8,32.03) v1(54.11,34.53) v1(54.1,20.98) v1(54.1,18.08) v1(54.2,65.15) v1(54.2,44.07) v1(54.18,43.31) v1(54.23,39.24) v1(54.25,26.21) v1(54.18,23.62) v1(54.36,37.64) v1(54.31,12.5) v1(54.31,6.96) v1(54.48,14.96) v1(54.48,9.65) v1(55.07,43.31) v1(55.17,14.35) v1(55.4,28.07) v1(55.65,19.33) v1(55.58,5.66) v1(55.73,51.31) v1(55.68,39.24) v1(55.7,16.61) v1(55.7,11.05) v1(55.8,37.64) v1(55.8,8.31) v1(55.91,21.84) v1(55.97,30.24) v1(56.01,0.89) v1(56.13,67.82) v1(56.16,50.57) v1(56.26,13.23) v1(56.31,53.09) v1(56.31,29.11) v1(56.41,54.25) v1(56.49,51.31) v1(56.62,35.79) v1(56.85,20.98) v1(56.85,7.72) v1(56.92,23.67) v1(56.95,10.06) v1(56.97,5.51) v1(57.15,17.81) v1(57.25,34.16) v1(57.18,26.21) v1(57.28,14.96) v1(57.38,65.1) v1(57.43,40.89) v1(57.43,12.29) v1(57.48,43.46) v1(57.91,58.14) v1(57.91,14.61) v1(57.91,3.48) v1(58.12,28.24) v1(58.22,25.96) v1(58.25,16.84) v1(58.32,39.27) v1(58.37,34.16) v1(58.45,37.67) v1(59,19.28) v1(59.03,17.09) v1(59.11,26.21) v1(59.13,21.72) v1(59.36,40.41) v1(59.36,10.03) v1(59.31,7.7) v1(59.41,44.7) v1(59.46,43.97) v1(59.41,34.19) v1(59.39,33.22) v1(59.39,29.13) v1(59.41,12.34) v1(59.51,51.28) v1(59.49,23.9) v1(59.51,5.51) v1(59.77,25.78) v1(59.82,0.89) v1(59.94,67.82) v1(59.94,14.58) v1(60.12,39.27) v1(60.25,37.67) v1(60.17,27.91) v1(60.43,44.7) v1(60.4,43.94) v1(60.48,59.72) v1(60.6,23.9) v1(60.66,19.18) v1(60.63,17.09) v1(60.68,21.67) v1(60.78,61.59) v1(61.24,41) v1(61.29,43.94) v1(61.52,49.99) v1(61.65,3.43) v1(61.7,33.01) v1(61.73,32.12) v1(61.9,39.27) v1(62.03,37.67) v1(62.15,23.95) v1(62.18,25.88) v1(62.18,21.62) v1(62.26,14.61) v1(62.23,12.32) v1(62.23,10.03) v1(62.2,7.72) v1(62.2,5.51) v1(62.28,65.89) v1(62.36,19.25) v1(62.59,17.07) v1(62.74,67.82) v1(63.02,33.01) v1(63.05,32.12) v1(63.22,26.9) v1(63.6,56.59) v1(63.63,0.89) v1(64.03,19.18) v1(64.16,57.38) v1(64.21,17.09) v1(64.36,25.93) v1(64.34,24) v1(64.36,21.67) v1(64.39,63.53) v1(64.47,62.38) v1(64.44,14.66) v1(64.41,12.37) v1(64.41,10.08) v1(64.39,7.77) v1(64.39,5.56) v1(64.59,33.05) v1(64.59,32.13) v1(64.8,59.61) v1(64.8,58.5) v1(65.02,56.54) v1(65.23,59.05) v1(65.41,34.98) v1(65.47,26.88) v1(65.56,62.38) v1(65.58,63.4) v1(65.63,59.61) v1(65.63,58.5) v1(65.68,57.38) v1(65.68,43.41) v1(65.68,42.52) v1(65.68,19.25) v1(65.68,3.43) v1(65.81,17.09) v1(66.27,25.93) v1(66.24,24) v1(66.27,21.67) v1(66.34,14.66) v1(66.32,12.37) v1(66.32,10.08) v1(66.29,7.77) v1(66.29,5.56) v1(66.47,49.56) v1(66.5,43.41) v1(66.5,42.52) v1(66.47,32.49) v1(66.5,31.62) v1(66.57,59.59) v1(66.57,58.45) v1(67.01,59.03) v1(67.34,50.75) v1(67.31,43.41) v1(67.31,42.52) v1(67.41,59.61) v1(67.44,58.45) v1(67.39,19.2) v1(67.44,17.09) v1(67.44,0.89) v1(67.56,67.82) v1(67.56,32.49) v1(67.47,27.51) v1(67.59,31.62) v1(68.02,48.87) v1(68.15,24) v1(68.17,25.93) v1(68.17,21.67) v1(68.25,14.66) v1(68.22,12.37) v1(68.22,10.08) v1(68.2,7.77) v1(68.2,5.56) v1(68.71,32.46) v1(68.68,31.6) v1(69.06,19.3) v1(69.19,65.79) v1(69.19,17.09) v1(69.8,39.24) v1(69.8,3.43) v1(69.93,37.64) v1(70,34.93) v1(70.05,24) v1(70.08,25.93) v1(70.08,21.67) v1(70.15,14.66) v1(70.13,12.37) v1(70.13,10.08) v1(70.1,7.77) v1(70.1,5.56) v1(70.21,67.82) v1(70.36,41.2) v1(70.54,31.12) v1(70.56,30.15) v1(70.69,19.18) v1(70.84,17.09) v1(71.15,39.24) v1(71.25,0.89) v1(71.27,37.64) v1(71.68,43) v1(71.73,31.12) v1(71.75,30.15) v1(71.96,24) v1(71.98,25.93) v1(71.98,21.67) v1(72.06,14.66) v1(72.03,12.37) v1(72.03,10.08) v1(72.01,7.77) v1(72.01,5.56) v1(72.31,58.72) v1(72.36,56.67) v1(72.42,39.4) v1(72.47,34.95) v1(72.39,19.23) v1(72.44,17.12) v1(72.54,37.8) v1(72.8,61.62) v1(72.95,30.15) v1(73.02,60.81) v1(72.97,31.12) v1(73.13,52.35) v1(73.36,61.62) v1(73.33,33.73) v1(73.58,49.48) v1(73.58,40.06) v1(73.76,3.38) v1(73.86,24) v1(73.89,25.93) v1(73.89,21.67) v1(73.96,14.66) v1(73.94,12.37) v1(73.94,10.08) v1(73.91,7.77) v1(73.91,5.56) v1(74.07,17.12) v1(74.14,32.41) v1(74.17,19.18) v1(74.45,38.76) v1(74.6,41.07) v1(74.75,52.4) v1(75.06,0.89) v1(75.11,34.9) v1(75.08,29.01) v1(75.56,17.09) v1(75.62,42.11) v1(75.62,39.78) v1(75.69,49.48) v1(75.77,24) v1(75.79,25.93) v1(75.79,21.67) v1(75.87,14.66) v1(75.84,12.37) v1(75.84,10.08) v1(75.82,7.77) v1(75.82,5.56) v1(75.95,19.18) v1(76.17,30.89) v1(76.17,29.92) v1(76.45,42.8) v1(76.56,38.76) v1(77.04,45.54) v1(77.27,30.89) v1(77.27,3.33) v1(77.29,29.92) v1(77.7,25.93) v1(77.67,24) v1(77.7,21.67) v1(77.75,12.37) v1(77.75,10.08) v1(77.72,7.77) v1(77.72,5.56) v1(77.77,14.66) v1(77.95,19.23) v1(77.88,17.02) v1(78.21,67.82) v1(78.46,29.9) v1(78.49,30.86) v1(78.49,0.89) v1(79.22,32.46) v1(79.6,25.93) v1(79.58,24) v1(79.6,21.67) v1(79.65,12.37) v1(79.65,10.08) v1(79.63,7.77) v1(79.63,5.56) v1(79.68,65.58) v1(79.68,14.66) v1(79.86,16.99) v1(79.93,45.92) v1(79.88,19.2) v1(79.98,33.99) v1(80.31,31.14) v1(80.31,30.18) v1(81.36,52.83) v1(81.41,31.14) v1(81.43,30.18) v1(81.51,25.93) v1(81.48,24) v1(81.51,21.67) v1(81.53,19.38) v1(81.56,16.99) v1(81.56,12.37) v1(81.56,10.08) v1(81.53,7.77) v1(81.58,14.66) v1(81.79,51.21) v1(81.94,40.44) v1(82.07,62.61) v1(82.27,59.49) v1(82.25,51.82) v1(82.19,37.69) v1(82.3,58.52) v1(82.63,31.12) v1(82.6,30.15) v1(82.68,52.4) v1(82.8,67.82) v1(82.85,62.05) v1(83.11,45.47) v1(83.24,51.26) v1(83.22,50.01) v1(83.24,48.82) v1(83.46,59.49) v1(83.39,32.41) v1(83.41,25.93) v1(83.39,24) v1(83.41,21.67) v1(83.44,19.38) v1(83.46,16.99) v1(83.46,12.37) v1(83.46,10.08) v1(83.44,7.77) v1(83.44,5.56) v1(83.49,58.52) v1(83.49,34.16) v1(83.49,14.66) v1(83.69,53.7) v1(83.9,41.3) v1(84.05,62.74) v1(83.97,43) v1(84.18,0.86) v1(84.58,54.99) v1(84.61,30.99) v1(84.63,30.12) v1(84.71,65.84) v1(84.91,45.47) v1(85.27,62.76) v1(85.32,25.93) v1(85.29,24) v1(85.32,21.67) v1(85.34,19.38) v1(85.37,16.99) v1(85.37,12.37) v1(85.37,10.08) v1(85.34,7.77) v1(85.34,5.56) v1(85.39,14.66) v1(85.65,30.99) v1(85.67,30.12) v1(85.93,3.1) v1(86.31,53.85) v1(86.28,53.01) v1(86.28,51.49) v1(86.28,49.89) v1(86.28,48.72) v1(86.28,46.96) v1(86.49,0.89) v1(86.61,67.82) v1(86.66,30.12) v1(86.69,30.99) v1(87.22,25.93) v1(87.2,24) v1(87.22,21.67) v1(87.25,19.38) v1(87.25,7.77) v1(87.25,5.56) v1(87.3,38.35) v1(87.27,16.99) v1(87.3,14.66) v1(87.27,12.37) v1(87.27,10.08) v1(87.4,54.97) v1(87.54,57.1) v1(87.58,32.33) v1(87.86,37.54) v1(87.96,64.11) v1(87.93,39.95) v1(88.11,53.09) v1(88.14,51.56) v1(88.11,49.96) v1(88.14,48.77) v1(88.62,65.66) v1(88.67,56.26) v1(88.72,44.12) v1(88.72,39.4) v1(88.72,30.86) v1(88.75,30) v1(88.82,53.82) v1(88.77,45.47) v1(89.13,25.93) v1(89.1,24) v1(89.13,21.67) v1(89.15,19.38) v1(89.15,7.77) v1(89.15,5.56) v1(89.18,16.99) v1(89.2,14.66) v1(89.18,12.37) v1(89.18,10.08) v1(89.33,61.01) v1(89.69,57.28) v1(89.76,30.86) v1(89.81,50.04) v1(89.79,30) v1(89.89,40.03) v1(90.09,55.14) v1(90.3,0.89) v1(90.42,67.82) v1(90.37,3.1) v1(90.73,63.07) v1(90.86,30.89) v1(90.83,30.02) v1(91.03,58.62) v1(91.03,25.93) v1(91.01,24) v1(91.03,21.67) v1(91.06,19.38) v1(91.06,7.77) v1(91.06,5.56) v1(91.08,16.99) v1(91.11,14.66) v1(91.08,12.37) v1(91.08,10.08) v1(91.26,56.31) v1(91.62,32.33) v1(91.82,53.8) v1(92.28,57.3) v1(92.68,30.96) v1(92.71,29.95) v1(92.94,25.93) v1(92.91,24) v1(92.94,21.67) v1(92.96,19.38) v1(92.96,7.77) v1(92.96,5.56) v1(93.04,47.52) v1(92.99,16.99) v1(93.01,14.66) v1(92.99,12.37) v1(92.99,10.08) v1(93.29,60.83) v1(93.29,44.91) v1(93.29,38.61) v1(93.47,51.59) v1(93.73,58.88) v1(93.78,30.96) v1(93.83,29.95) v1(93.98,54) v1(94.11,0.89) v1(94.23,67.82) v1(94.82,49.4) v1(94.84,25.93) v1(94.82,24) v1(94.84,21.67) v1(94.87,19.38) v1(94.87,7.77) v1(94.87,5.56) v1(94.82,3.1) v1(94.97,30.94) v1(94.97,29.92) v1(94.89,16.99) v1(94.92,14.66) v1(94.89,12.37) v1(94.89,10.08) v1(95.5,57.23) v1(95.63,32.33) v1(95.71,63.25) v1(96.6,38.66) v1(96.75,25.93) v1(96.72,24) v1(96.75,21.67) v1(96.77,19.38) v1(96.8,16.99) v1(96.82,14.66) v1(96.8,12.37) v1(96.8,10.08) v1(96.77,7.77) v1(96.77,5.56) v1(97.1,31.04) v1(97.1,30.07) v1(97.92,0.89) v1(98.04,67.82) v1(98.09,21.62) v1(98.12,19.33) v1(98.15,16.94) v1(98.17,14.61) v1(98.15,12.32) v1(98.15,10.03) v1(98.2,31.04) v1(98.22,30.07) v1(98.22,25.96) v1(98.2,23.98) v1(98.55,59.54) v1(98.67,57.23) v1(98.78,63.58) v1(98.78,61.72) v1(98.96,42.95) v1(99.26,3.1) v1(99.42,31.01) v1(99.39,30.05) v1(99.54,21.56) v1(99.57,19.28) v1(99.57,7.67) v1(99.57,5.46) v1(99.67,25.91) v1(99.64,23.93) v1(99.59,16.89) v1(99.62,14.55) v1(99.59,12.27) v1(99.59,9.98) v1(99.75,43.82) v1(99.95,59.54) v1(100.15,63.55) v1(100.1,57.4) v1(100.25,61.72) v1(100.46,64.64) v1(100.46,60.78) v1(100.41,32.31) v1(100.41,28.09) v1(100.51,41.91) v1(100.51,38.56) v1(100.79,45.03) v1(100.94,42.37) v1(100.99,25.93) v1(101.14,36.02) v1(101.35,60.78) v1(101.37,30.91) v1(101.37,29.95) v1(101.47,59.51) v1(101.65,57.33) v1(101.59,23.75) v1(101.73,0.89) v1(101.85,67.82) v1(101.78,63.55) v1(101.83,61.7) v1(101.8,21.62) v1(101.83,19.33) v1(101.85,16.94) v1(101.85,12.32) v1(101.85,10.03) v1(101.83,7.72) v1(101.83,5.51) v1(101.88,14.61) v1(102.34,43.71) v1(102.29,25.93) v1(102.46,30.91) v1(102.49,29.95) v1(102.72,45.69) v1(103.17,57.33) v1(103.35,63.55) v1(103.35,55.19) v1(103.37,24.02) v1(103.28,14.76) v1(103.4,61.75) v1(103.38,56.18) v1(103.38,54.23) v1(103.56,29.92) v1(103.63,59.51) v1(103.63,45.42) v1(103.66,44.04) v1(103.63,42.65) v1(103.61,41.12) v1(103.61,39.4) v1(103.63,38.2) v1(103.63,36.91) v1(103.58,30.89) v1(103.63,25.96) v1(103.73,17.02) v1(103.71,3.1) v1(104.04,64.67) v1(104.19,21.67) v1(104.47,35.66) v1(104.5,59.51) v1(104.57,57.38) v1(104.72,63.02) v1(104.72,5.49) v1(104.85,55.65) v1(104.85,19.35) v1(104.85,14.78) v1(104.8,12.32) v1(104.8,10.06) v1(104.77,7.8) v1(104.93,35.23) v1(104.9,33.96) v1(104.9,32.87) v1(104.88,30.61) v1(104.9,28.52) v1(104.88,27.28) v1(104.9,25.96) v1(105.1,56.49) v1(105.56,45.49) v1(105.56,39.42) v1(105.54,0.89) v1(105.66,67.82) v1(105.59,59.49) v1(105.61,44.04) v1(105.61,42.65) v1(105.92,61.82) v1(105.97,16.92) v1(106.07,23.98) v1(106.07,19.35) v1(106.45,44.5) v1(106.63,5.49) v1(106.73,34.01) v1(106.76,30.94) v1(106.73,28.45) v1(106.73,27.23) v1(106.76,25.93) v1(106.76,14.78) v1(106.71,12.32) v1(106.71,10.06) v1(106.68,7.8) v1(106.96,60.78) v1(106.91,35.99) v1(107.06,54.97) v1(107.09,21.59) v1(107.21,58.39) v1(107.37,16.89) v1(107.44,44.91) v1(107.62,39.57) v1(107.85,42.65) v1(108.15,3.1) v1(108.33,44.91) v1(108.33,43.08) v1(108.31,19.28) v1(108.46,25.96) v1(108.38,21.64) v1(108.53,5.49) v1(108.67,63.01) v1(108.66,14.78) v1(108.61,12.32) v1(108.61,10.06) v1(108.58,7.8) v1(108.71,61.21) v1(108.71,60.6) v1(108.71,58.42) v1(108.71,57.79) v1(108.69,17.02) v1(108.86,40.89) v1(109.35,0.89) v1(109.4,44.96) v1(109.37,43.1) v1(109.42,23.93) v1(109.47,67.82) v1(109.57,60.64) v1(109.65,58.23) v1(109.7,33.12) v1(109.96,38.81) v1(109.96,37.77) v1(109.91,30.86) v1(109.91,29.11) v1(109.91,27.36) v1(109.98,57.25) v1(110.34,19.28) v1(110.47,60.09) v1(110.44,42.09) v1(110.44,5.49) v1(110.57,14.78) v1(110.52,12.32) v1(110.52,10.06) v1(110.49,7.8) v1(110.67,43.23) v1(110.67,40.94) v1(110.64,23.9) v1(110.62,21.56) v1(110.59,17.02) v1(110.74,39.67) v1(110.9,64.92) v1(111.18,61.7) v1(111.18,60.58) v1(111.18,59.46) v1(111.38,25.88) v1(111.99,30.81) v1(111.99,29.11) v1(111.99,27.3) v1(112.34,5.49) v1(112.47,19.35) v1(112.47,14.78) v1(112.42,12.32) v1(112.42,10.06) v1(112.39,7.8) v1(112.5,17.02) v1(112.6,25.93) v1(112.65,21.64) v1(112.6,3.1) v1(112.83,39.67) v1(112.88,67.79) v1(112.9,43.23) v1(112.9,40.94) v1(112.9,23.85) v1(113.08,42.04) v1(113.13,34.98) v1(113.16,0.89) v1(113.93,59.8) v1(114.02,27.28) v1(114.17,29.11) v1(114.25,5.49) v1(114.35,35) v1(114.33,12.32) v1(114.33,10.06) v1(114.3,7.8) v1(114.38,36.5) v1(114.38,33.76) v1(114.38,19.35) v1(114.4,17.02) v1(114.38,14.78) v1(114.53,43.15) v1(114.63,42.27) v1(114.6,30.78) v1(114.71,40.87) v1(114.83,21.64) v1(114.91,25.76) v1(114.88,23.88) v1(115.19,61.39) v1(115.19,39.95) v1(115.85,30.78) v1(115.9,39.09) v1(115.95,26.77) v1(116.08,62.92) v1(116.13,59.8) v1(116.08,36.47) v1(116.08,34.95) v1(116.08,33.73) v1(116.1,31.98) v1(116.15,5.49) v1(116.2,29.19) v1(116.23,12.32) v1(116.23,10.06) v1(116.2,7.8) v1(116.28,19.35) v1(116.31,17.02) v1(116.28,14.78) v1(116.81,27.58) v1(116.94,25.76) v1(116.97,0.89) v1(117.04,21.64) v1(117.04,3.1) v1(117.09,67.82) v1(117.14,41.38) v1(117.12,23.8) v1(117.22,39.62) v1(117.36,61.3) v1(117.35,58.88) v1(117.35,56.64) v1(117.4,30.73) v1(117.63,64.59) v1(118.06,5.49) v1(118.14,12.32) v1(118.14,10.06) v1(118.11,7.8) v1(118.24,54.81) v1(118.19,19.35) v1(118.21,17.02) v1(118.19,14.78) v1(118.47,29.24) v1(118.57,34.98) v1(118.57,22.28) v1(118.69,59.95) v1(118.82,58.98) v1(118.8,56.57) v1(118.87,25.55) v1(119.43,43.79) v1(119.63,58.88) v1(119.63,56.64) v1(119.8,62.97) v1(119.81,61.29) v1(119.79,54.84) v1(119.79,33.2) v1(119.89,48.31) v1(119.89,46.38) v1(119.96,5.49) v1(120.04,21.51) v1(120.04,12.32) v1(120.04,10.06) v1(120.02,7.8) v1(120.09,19.35) v1(120.12,17.02) v1(120.09,14.78) v1(120.22,41.58) v1(120.22,39.34) v1(120.32,24.03) v1(120.55,55.8) v1(120.5,27.2) v1(120.78,0.89) v1(120.9,67.82) v1(121.08,31.83) v1(121.36,54.86) v1(121.36,52.63) v1(121.51,58.9) v1(121.54,48.36) v1(121.56,46.13) v1(121.49,3.1) v1(121.61,60) v1(121.62,39.14) v1(121.69,43.97) v1(121.69,41.73) v1(121.87,5.49) v1(121.89,56.74) v1(121.95,25.68) v1(121.95,12.32) v1(121.95,10.06) v1(121.92,7.8) v1(122,19.35) v1(122.02,17.02) v1(122,14.78) v1(122.15,51.97) v1(122.1,28.83) v1(122.1,21.51) v1(122.17,63.27) v1(122.33,45.97) v1(122.28,35.64) v1(122.45,58.95) v1(122.43,56.59) v1(122.5,48.56) v1(122.71,41.5) v1(122.73,39.42) v1(123.14,55.98) v1(123.23,61.23) v1(123.39,58.93) v1(123.39,56.59) v1(123.52,34.26) v1(123.55,27.3) v1(123.6,49.53) v1(123.67,52.25) v1(123.85,44.17) v1(123.93,30.63) v1(123.98,48.34) v1(124,46.25) v1(124.08,41.83) v1(124.21,58.88) v1(124.21,56.64) v1(124.18,23.6) v1(124.36,54.79) v1(124.56,5.44) v1(124.61,51.84) v1(124.66,49.83) v1(124.64,21.51) v1(124.64,12.27) v1(124.64,10.01) v1(124.61,7.75) v1(124.59,0.89) v1(124.71,67.82) v1(124.69,19.3) v1(124.71,16.97) v1(124.69,14.73) v1(124.82,41.53) v1(124.84,39.42) v1(124.79,36.09) v1(124.82,34.26) v1(125.15,59.99) v1(125.12,45.36) v1(125.43,57.86) v1(125.37,29.11) v1(125.5,32.16) v1(125.63,55.98) v1(125.93,3.1) v1(126.16,54.79) v1(126.19,25.86) v1(126.39,52.7) v1(126.39,39.4) v1(126.39,36.07) v1(126.42,34.24) v1(126.95,33.58) v1(126.95,30.63) v1(126.87,21.54) v1(126.92,19.33) v1(126.95,16.99) v1(127.03,10.01) v1(126.97,7.7) v1(127.03,5.49) v1(127.15,14.55) v1(127.08,12.27) v1(127.18,36.88) v1(127.51,66.5) v1(127.66,54.81) v1(127.76,28.04) v1(127.86,41.55) v1(127.79,25.32) v1(127.91,52.73) v1(127.89,39.42) v1(127.97,34.85) v1(127.99,37.72) v1(128.04,22.28) v1(128.09,30.64) v1(128.27,24.59) v1(128.32,29.82) v1(128.35,27.15) v1(128.4,32.05) v1(128.4,0.89) v1(128.52,67.82) v1(128.52,66.78) v1(128.55,35.69) v1(128.85,38.56) v1(129.16,54.79) v1(129.24,52.7) v1(129.29,51.94) v1(129.29,49.83) v1(129.31,19.35) v1(129.41,36.5) v1(129.46,33.12) v1(129.44,10.01) v1(129.46,7.7) v1(129.54,16.94) v1(129.54,14.61) v1(129.51,12.27) v1(129.51,5.49) v1(129.67,66.78) v1(129.67,41.53) v1(129.67,39.42) v1(129.84,31.17) v1(130.23,37.26) v1(130.38,3.1) v1(130.66,34.32) v1(130.81,66.78) v1(131.01,41.45) v1(131.17,38.23) v1(131.22,54.79) v1(131.29,52.7) v1(131.34,51.94) v1(131.34,49.83) v1(131.62,10.03) v1(131.67,12.27) v1(131.85,19.28) v1(131.78,16.94) v1(131.78,14.58) v1(131.88,35.56) v1(132.05,5.46) v1(132.11,7.77) v1(132.18,39.27) v1(132.21,0.89) v1(132.33,67.82) v1(132.36,22.66) v1(132.94,49.81) v1(133.07,39.32) v1(133.07,25.78) v1(133.17,41.45) v1(133.27,54.79) v1(133.35,52.7) v1(133.35,51.89) v1(133.35,37.31) v1(133.4,27.61) v1(133.5,19.2) v1(133.71,16.92) v1(133.81,46.05) v1(133.81,21.13) v1(133.86,14.58) v1(133.91,48.13) v1(133.91,43.76) v1(133.93,12.27) v1(133.88,10.03) v1(133.99,24.21) v1(134.16,58.19) v1(134.16,57.43) v1(134.44,42.65) v1(134.42,39.85) v1(134.47,7.72) v1(134.57,37.34) v1(134.52,5.51) v1(134.82,3.1) v1(134.87,39.12) v1(134.95,17.68) v1(135.05,57.43) v1(135.23,54.81) v1(135.2,52.73) v1(135.2,51.89) v1(135.2,49.78) v1(135.18,20.93) v1(135.28,48.31) v1(135.33,28.96) v1(135.43,22.68) v1(135.53,46.23) v1(135.56,43.79) v1(135.56,25.78) v1(135.59,14.48) v1(135.79,41.22) v1(135.94,57.43) v1(135.92,40.16) v1(136.02,0.89) v1(136.14,67.82) v1(136.09,37.36) v1(136.27,16.03) v1(136.35,10.03) v1(136.42,12.34) v1(136.65,52.68) v1(136.63,19.41) v1(136.73,57.4) v1(136.68,54.81) v1(136.7,51.89) v1(136.8,63.96) v1(136.83,49.83) v1(136.86,22.66) v1(136.96,7.72) v1(137.06,41.38) v1(137.01,24.26) v1(137.03,12.95) v1(137.01,5.51) v1(137.11,45.14) v1(137.13,42.62) v1(137.08,27.36) v1(137.31,38.66) v1(137.29,34.67) v1(137.29,32) v1(137.44,47.78) v1(137.49,54.94) v1(137.59,57.43) v1(137.79,16.74) v1(138.18,55.68) v1(138.25,28.45) v1(138.35,24.16) v1(138.3,21.13) v1(138.46,53.31) v1(138.43,51.08) v1(138.4,42.7) v1(138.38,18.19) v1(138.48,57.43) v1(138.53,25.83) v1(138.58,43.99) v1(138.66,39.9) v1(138.58,36.53) v1(138.58,33.86) v1(138.58,31.19) v1(138.68,9.93) v1(138.79,49.2) v1(138.84,46.84) v1(138.79,13.89) v1(138.89,11.05) v1(139.24,15.21) v1(139.27,3.1) v1(139.37,57.43) v1(139.34,7.54) v1(139.42,56.72) v1(139.4,5.49) v1(139.57,18.52) v1(139.73,54.61) v1(139.67,52.32) v1(139.7,26.92) v1(139.73,8.08) v1(139.78,44.02) v1(139.8,22.63) v1(139.83,0.89) v1(139.95,30.15) v1(139.9,25.58) v1(140.03,41.35) v1(140.08,67.74) v1(140.11,64.74) v1(140.46,50.57) v1(140.46,11.68) v1(140.51,60.96) v1(140.54,45.9) v1(140.54,20.22) v1(140.61,15.72) v1(140.72,40.64) v1(140.84,13.06) v1(140.92,53.14) v1(141.05,58.22) v1(141.02,16.99) v1(141.15,55.63) v1(141.33,42.67) v1(141.35,24.05) v1(141.4,28.63) v1(141.4,8.92) v1(141.83,5.64) v1(142.24,29.84) v1(142.82,3) v1(143.31,7.11) v1(143.51,31.12) v1(143.64,0.89) v1(143.76,67.82) v1(144.78,29.84) v1(144.91,60.88) v1(146.05,31.12) v1(146.18,7.57) v1(147.32,29.84) v1(148.03,67.82) v1(148.49,0.91) v1(148.59,34.93) v1(148.62,7.57) v1(150.98,63.78) v1(151.21,7.54) v1(151.26,0.89) v1(151.41,67.79) v1(151.94,12.73) v1(152.96,60.88) v1(152.96,20.27) v1(152.93,15.11) v1(153.01,32.03) v1(152.98,31.45) v1(153.11,30.56) v1(153.11,21.79) v1(153.11,12.52) v1(153.09,10.31) v1(153.8,7.54) v1(154.08,33.05) v1(154.08,27.97) v1(154.15,25.43) v1(154.13,22.83) v1(154.1,12.67) v1(154.23,30.61) v1(154.36,27.03) v1(154.28,20.47) v1(154.31,15.44) v1(154.41,26.21) v1(154.56,67.79) v1(154.66,63.7) v1(154.79,24.71) v1(154.99,18.95) v1(155.07,0.89) v1(155.14,8.31) v1(155.5,34.24) v1(155.5,31.24) v1(155.47,16) v1(155.52,11.84) v1(155.68,23.8) v1(155.83,21.82) v1(155.88,32.79) v1(155.88,17.53) v1(155.88,9.91) v1(156.59,67.82) v1(156.59,64.14) v1(156.59,60.33) v1(156.59,56.52) v1(156.59,52.7) v1(156.59,48.9) v1(156.59,45.09) v1(156.59,41.27) v1(156.59,37.47) v1(156.59,33.66) v1(156.59,29.84) v1(156.59,26.03) v1(156.59,22.23) v1(156.59,18.41) v1(156.59,14.61) v1(156.59,10.79) v1(156.59,6.98) v1(156.59,3.17) v2(22.91,28.96) v2(22.96,26.8) v2(26.32,28.85) v2(26.37,26.77) v2(28.14,18.75) v2(28.15,18.07) v2(28.42,20.22) v2(28.85,15.88) v2(28.85,15.42) v2(29.56,17.55) v2(29.56,17.15) v2(30.28,15.88) v2(30.28,15.42) v2(30.89,18.72) v2(30.96,17.28) v2(31.02,15.86) v2(31.11,19.28) v2(31.84,15.91) v2(32.13,17.25) v2(32.68,15.88) v2(32.84,18.8) v2(33.12,19.74) v2(33.83,18.75) v2(34.44,17.25) v2(34.95,17.7) v2(35.97,20.9) v2(36.25,17.63) v2(36.91,31.85) v2(36.93,30.23) v2(36.96,28.65) v2(36.88,27.03) v2(37.01,23.93) v2(37.76,19.27) v2(37.76,16.91) v2(38.4,25.4) v2(39.27,30.25) v2(39.27,28.65) v2(41.55,30.25) v2(42.16,34.28) v2(47.04,27.99) v2(62.88,29.28) v2(64.72,28.1) v2(65.5,28.09) v2(66.4,28.1) v2(113.47,55.66) v2(114,55.65) v2(151.13,18.41) v3(0.51,47.29) v3(0.51,46.41) v3(0.51,45.52) v3(0.51,40.18) v3(0.51,39.29) v3(0.51,38.4) v3(0.51,35.61) v3(0.51,34.72) v3(0.51,33.83) v3(0.51,28.5) v3(0.51,27.61) v3(0.51,26.72) v3(0.51,24.18) v3(0.51,23.29) v3(0.51,22.4) v3(0.51,17.07) v3(0.51,16.18) v3(0.51,15.29) v3(0.51,12.55) v3(0.51,11.66) v3(0.51,10.77) v3(0.51,5.44) v3(0.51,4.55) v3(0.51,3.66) v3(0.76,53.01) v3(0.76,51.69) v3(0.91,62.92) v3(0.94,61.49) v3(1.27,47.29) v3(1.27,46.41) v3(1.27,45.52) v3(1.27,40.18) v3(1.27,39.29) v3(1.27,38.4) v3(1.27,35.61) v3(1.27,34.72) v3(1.27,33.83) v3(1.27,28.5) v3(1.27,27.61) v3(1.27,26.72) v3(1.27,24.18) v3(1.27,23.29) v3(1.27,22.4) v3(1.27,17.07) v3(1.27,16.18) v3(1.27,15.29) v3(1.27,12.55) v3(1.27,11.66) v3(1.27,10.77) v3(1.27,5.44) v3(1.27,4.55) v3(1.27,3.66) v3(1.94,52.36) v3(2.03,47.29) v3(2.03,46.41) v3(2.03,45.52) v3(2.03,40.18) v3(2.03,39.29) v3(2.03,38.4) v3(2.03,35.61) v3(2.03,34.72) v3(2.03,33.83) v3(2.03,28.5) v3(2.03,27.61) v3(2.03,26.72) v3(2.03,24.18) v3(2.03,23.29) v3(2.03,22.4) v3(2.03,17.07) v3(2.03,16.18) v3(2.03,15.29) v3(2.03,12.55) v3(2.03,11.66) v3(2.03,10.77) v3(2.03,5.44) v3(2.03,4.55) v3(2.03,3.66) v3(2.09,62.18) v3(2.79,47.29) v3(2.79,46.41) v3(2.79,45.52) v3(2.79,40.18) v3(2.79,39.29) v3(2.79,38.4) v3(2.79,35.61) v3(2.79,34.72) v3(2.79,33.83) v3(2.79,28.5) v3(2.79,27.61) v3(2.79,26.72) v3(2.79,24.18) v3(2.79,23.29) v3(2.79,22.4) v3(2.79,17.07) v3(2.79,16.18) v3(2.79,15.29) v3(2.79,12.55) v3(2.79,11.66) v3(2.79,10.77) v3(2.79,5.44) v3(2.79,4.55) v3(2.79,3.66) v3(3,53.06) v3(3,51.64) v3(3.43,62.92) v3(3.43,61.47) v3(3.56,47.29) v3(3.56,46.41) v3(3.56,45.52) v3(3.56,40.18) v3(3.56,39.29) v3(3.56,38.4) v3(3.56,35.61) v3(3.56,34.72) v3(3.56,33.83) v3(3.56,28.5) v3(3.56,27.61) v3(3.56,26.72) v3(3.56,24.18) v3(3.56,23.29) v3(3.56,22.4) v3(3.56,17.07) v3(3.56,16.18) v3(3.56,15.29) v3(3.56,12.55) v3(3.56,11.66) v3(3.56,10.77) v3(3.56,5.44) v3(3.56,4.55) v3(3.56,3.66) v3(5.05,53.04) v3(5.03,51.64) v3(5.16,61.47) v3(5.18,62.97) v3(5.26,3.56) v3(5.26,2.79) v3(5.26,2.03) v3(5.26,1.27) v3(5.26,0.51) v3(6.14,3.56) v3(6.14,2.79) v3(6.14,2.03) v3(6.14,1.27) v3(6.14,0.51) v3(6.27,62.18) v3(6.29,52.31) v3(7.04,51.66) v3(7.03,3.56) v3(7.03,2.79) v3(7.03,2.03) v3(7.03,1.27) v3(7.03,0.51) v3(7.29,62.92) v3(7.29,61.44) v3(7.39,53.06) v3(12.37,3.56) v3(12.37,2.79) v3(12.37,2.03) v3(12.37,1.27) v3(12.37,0.51) v3(13.26,3.56) v3(13.26,2.79) v3(13.26,2.03) v3(13.26,1.27) v3(13.26,0.51) v3(14.15,3.56) v3(14.15,2.79) v3(14.15,2.03) v3(14.15,1.27) v3(14.15,0.51) v3(76.27,57.99) v3(76.27,56.59) v3(76.27,55.89) v3(76.97,57.99) v3(76.97,57.29) v3(76.97,56.59) v3(76.97,55.89) v3(76.97,55.19) v3(77.67,57.99) v3(77.67,57.29) v3(77.67,56.59) v3(77.67,55.89) v3(77.67,55.19) v3(78.37,57.99) v3(78.37,57.29) v3(78.37,56.59) v3(78.37,55.89) v3(78.37,55.19) v3(79.07,57.99) v3(79.07,57.29) v3(79.07,56.59) v3(79.07,55.89) v3(79.07,55.19) v3(96.21,51.8) v3(96.91,53.9) v3(96.91,53.2) v3(96.91,52.5) v3(96.91,51.8) v3(96.91,51.1) v3(97.61,53.9) v3(97.61,53.2) v3(97.61,52.5) v3(97.61,51.8) v3(98.31,53.9) v3(98.31,53.2) v3(98.31,52.5) v3(98.31,51.8) v3(99.01,52.5) v3(99.01,51.8) v3(99.01,51.1) v3(102.26,51.54) v3(103,51.18) v3(103.71,50.83) v3(142.24,57.79) v3(142.24,56.52) v3(142.24,52.7) v3(142.24,45.09) v3(142.24,41.27) v3(142.24,37.47) v3(142.24,33.66) v3(142.24,22.23) v3(142.24,18.41) v3(142.24,14.61) v3(142.24,10.79) v3(143.51,59.05) v3(143.51,55.25) v3(143.51,53.98) v3(143.51,42.55) v3(143.51,38.73) v3(143.51,34.93) v3(143.51,19.69) v3(143.51,15.88) v3(143.51,12.06) v3(143.51,9.52) v3(144.78,56.52) v3(144.78,52.7) v3(144.78,48.9) v3(144.78,45.09) v3(144.78,41.27) v3(144.78,37.47) v3(144.78,22.23) v3(144.78,10.79) v3(146.05,59.05) v3(146.05,55.25) v3(146.05,53.98) v3(146.05,50.16) v3(146.05,42.55) v3(146.05,38.73) v3(146.05,34.93) v3(146.05,19.69) v3(146.05,15.88) v3(146.05,12.06) v3(146.05,9.52) v3(147.32,56.52) v3(147.32,52.7) v3(147.32,48.9) v3(147.32,41.27) v3(147.32,37.47) v3(147.32,22.23) v3(147.32,10.79) v3(148.59,59.05) v3(148.59,42.55) v3(148.59,38.73) v3(148.59,31.12) v3(148.59,19.69) v3(148.59,15.88) v3(148.59,12.06) v3(148.59,9.52) v3(149.86,57.79) v3(149.86,52.7) v3(149.86,51.44) v3(149.86,43.82) v3(149.86,40.01) v3(149.86,36.2) v3(149.86,32.38) v3(149.86,28.58) v3(149.86,10.79) v3(151.13,59.05) v3(151.13,55.25) v3(151.13,53.98) v3(151.13,50.16) v3(151.13,48.9) v3(151.13,45.09) v3(151.13,43.82) v3(151.13,40.01) v3(151.13,38.73) v3(151.13,34.93) v3(151.13,29.84) v3(151.13,28.58) v3(151.13,12.06) v3(151.13,9.52) v3(152.4,57.79) v3(152.4,56.52) v3(152.4,52.7) v3(152.4,51.44) v3(152.4,47.62) v3(152.4,46.36) v3(152.4,42.55) v3(152.4,41.27) v3(152.4,37.47) v3(152.4,36.2) v3(152.4,32.38) v3(152.4,31.12) v3(152.4,22.23) v3(152.4,20.95) v3(152.4,15.88) v3(152.4,12.06) v3(152.4,10.79) v3(153.67,59.05) v3(153.67,55.25) v3(153.67,53.98) v3(153.67,50.16) v3(153.67,48.9) v3(153.67,45.09) v3(153.67,43.82) v3(153.67,40.01) v3(153.67,38.73) v3(153.67,34.93) v3(153.67,29.84) v3(153.67,28.58) v3(153.67,19.69) v3(153.67,14.61) v3(153.67,13.33) v3(153.67,9.52) v4(5.4,58.88) v4(6.24,58.88) v4(7.08,58.88) v4(13,56.64) v4(63.23,52.85) v4(63.23,52.15) v4(63.93,52.15) v4(64.63,52.85) v4(64.63,52.15) v4(64.63,51.45) v4(80.42,42.19) v4(90.93,40.46) v4(90.93,39.7) v4(91.57,40.46) v4(91.57,39.7) v4(92.2,40.46) v4(92.2,39.7) v4(92.84,40.46) v4(110.85,52.3) v4(110.85,49.25) v4(111.86,52.3) v4(111.86,51.28) v4(111.86,50.27) v4(111.86,49.25) v4(111.86,48.23) v4(112.88,53.31) v4(112.88,52.3) v4(112.88,51.28) v4(112.88,50.27) v4(112.88,49.25) v4(112.88,48.23) v4(112.88,47.22) v4(113.64,51.28) v4(113.64,50.27) v4(113.64,49.25) v4(113.64,48.23) v4(113.64,47.22) v4(115.29,52.3) v4(115.29,51.28) v4(115.29,50.27) v4(115.29,49.25) v4(115.29,48.23) v4(115.29,47.22) v4(116.05,53.31) v4(116.05,52.3) v4(116.05,51.28) v4(116.05,50.27) v4(116.05,49.25) v4(116.05,48.23) v4(116.05,47.22) v4(116.94,49.25) v4(116.94,48.23) v5(51.77,50.32) v5(51.77,49.91) v5(52.21,50.32) v5(52.64,50.32) v5(52.64,49.91) v5(53.08,50.31) v5(53.08,49.9)
